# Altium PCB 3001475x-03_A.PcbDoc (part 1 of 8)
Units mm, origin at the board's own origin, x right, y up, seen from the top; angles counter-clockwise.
Board outline 100 x 72 mm, 12 copper layers (Top Layer, L2 GND, Layer 3, L4 GND, Layer 5, L6 PWR, L7 3V3, Layer 8, L9 GND, Layer 10, L11 GND, Bottom Layer), stack 1.735 mm thick; 428 components, 499 nets, 1973 pads, 1473 vias.
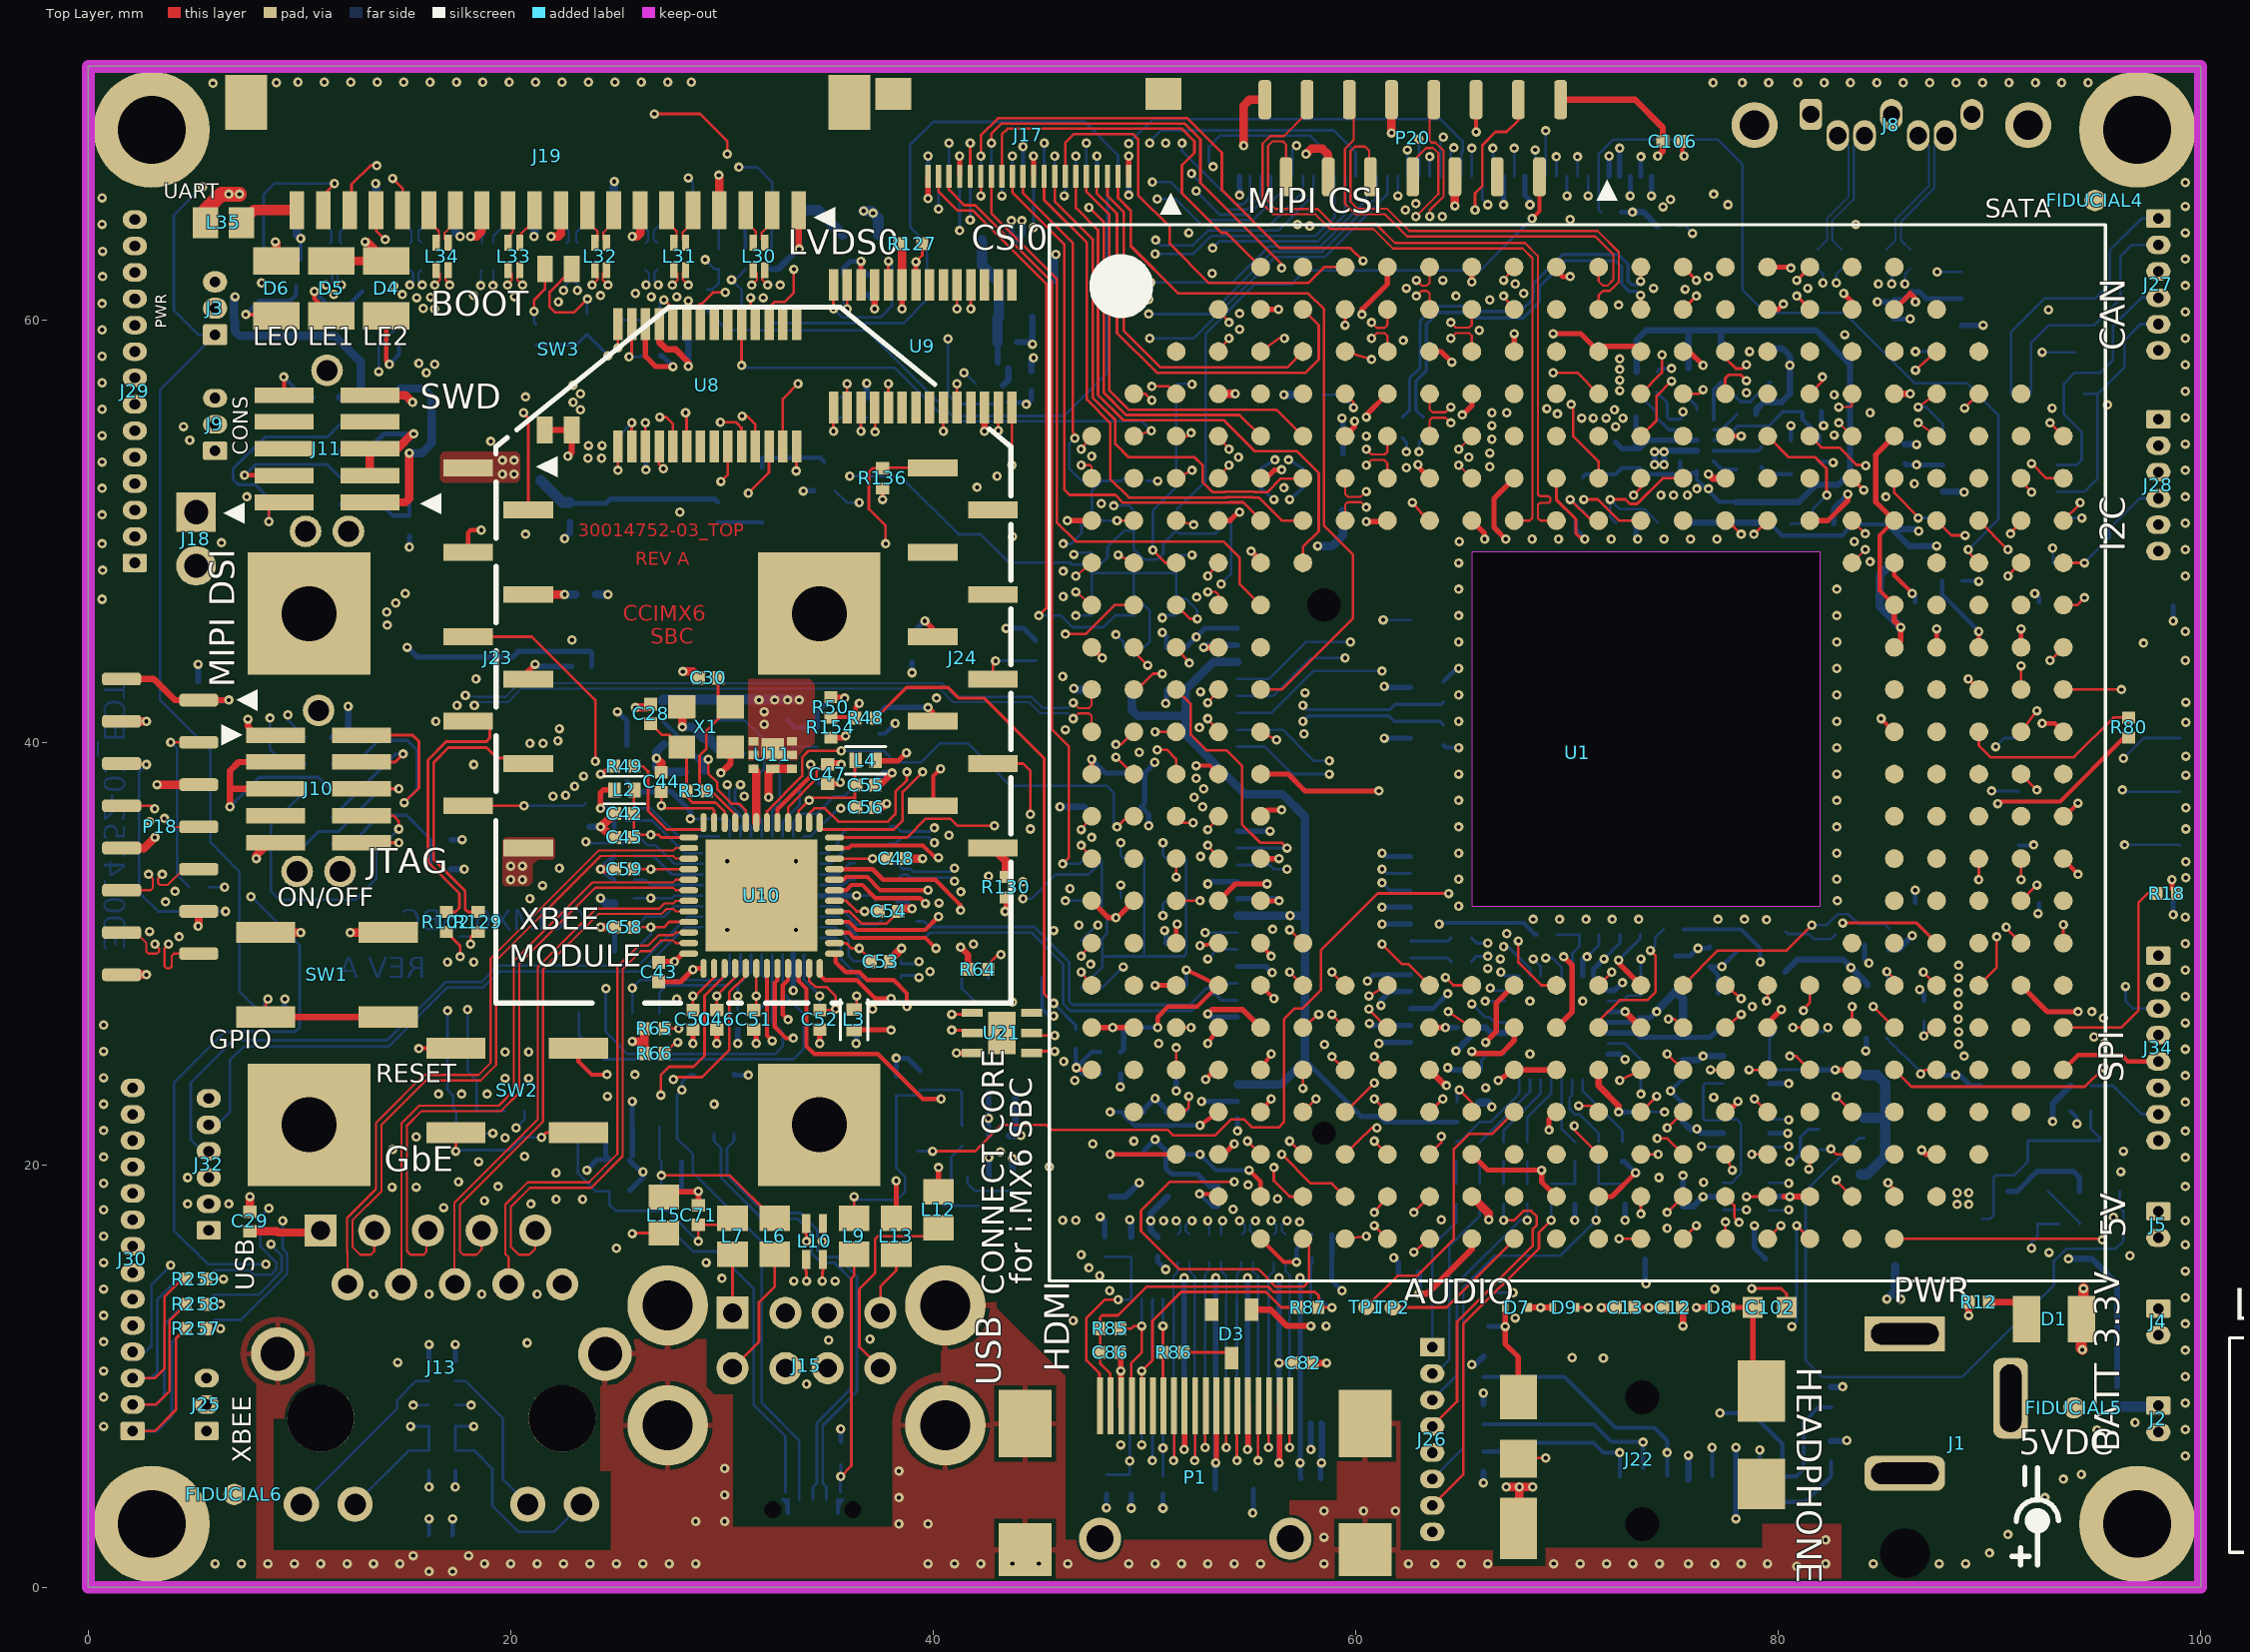
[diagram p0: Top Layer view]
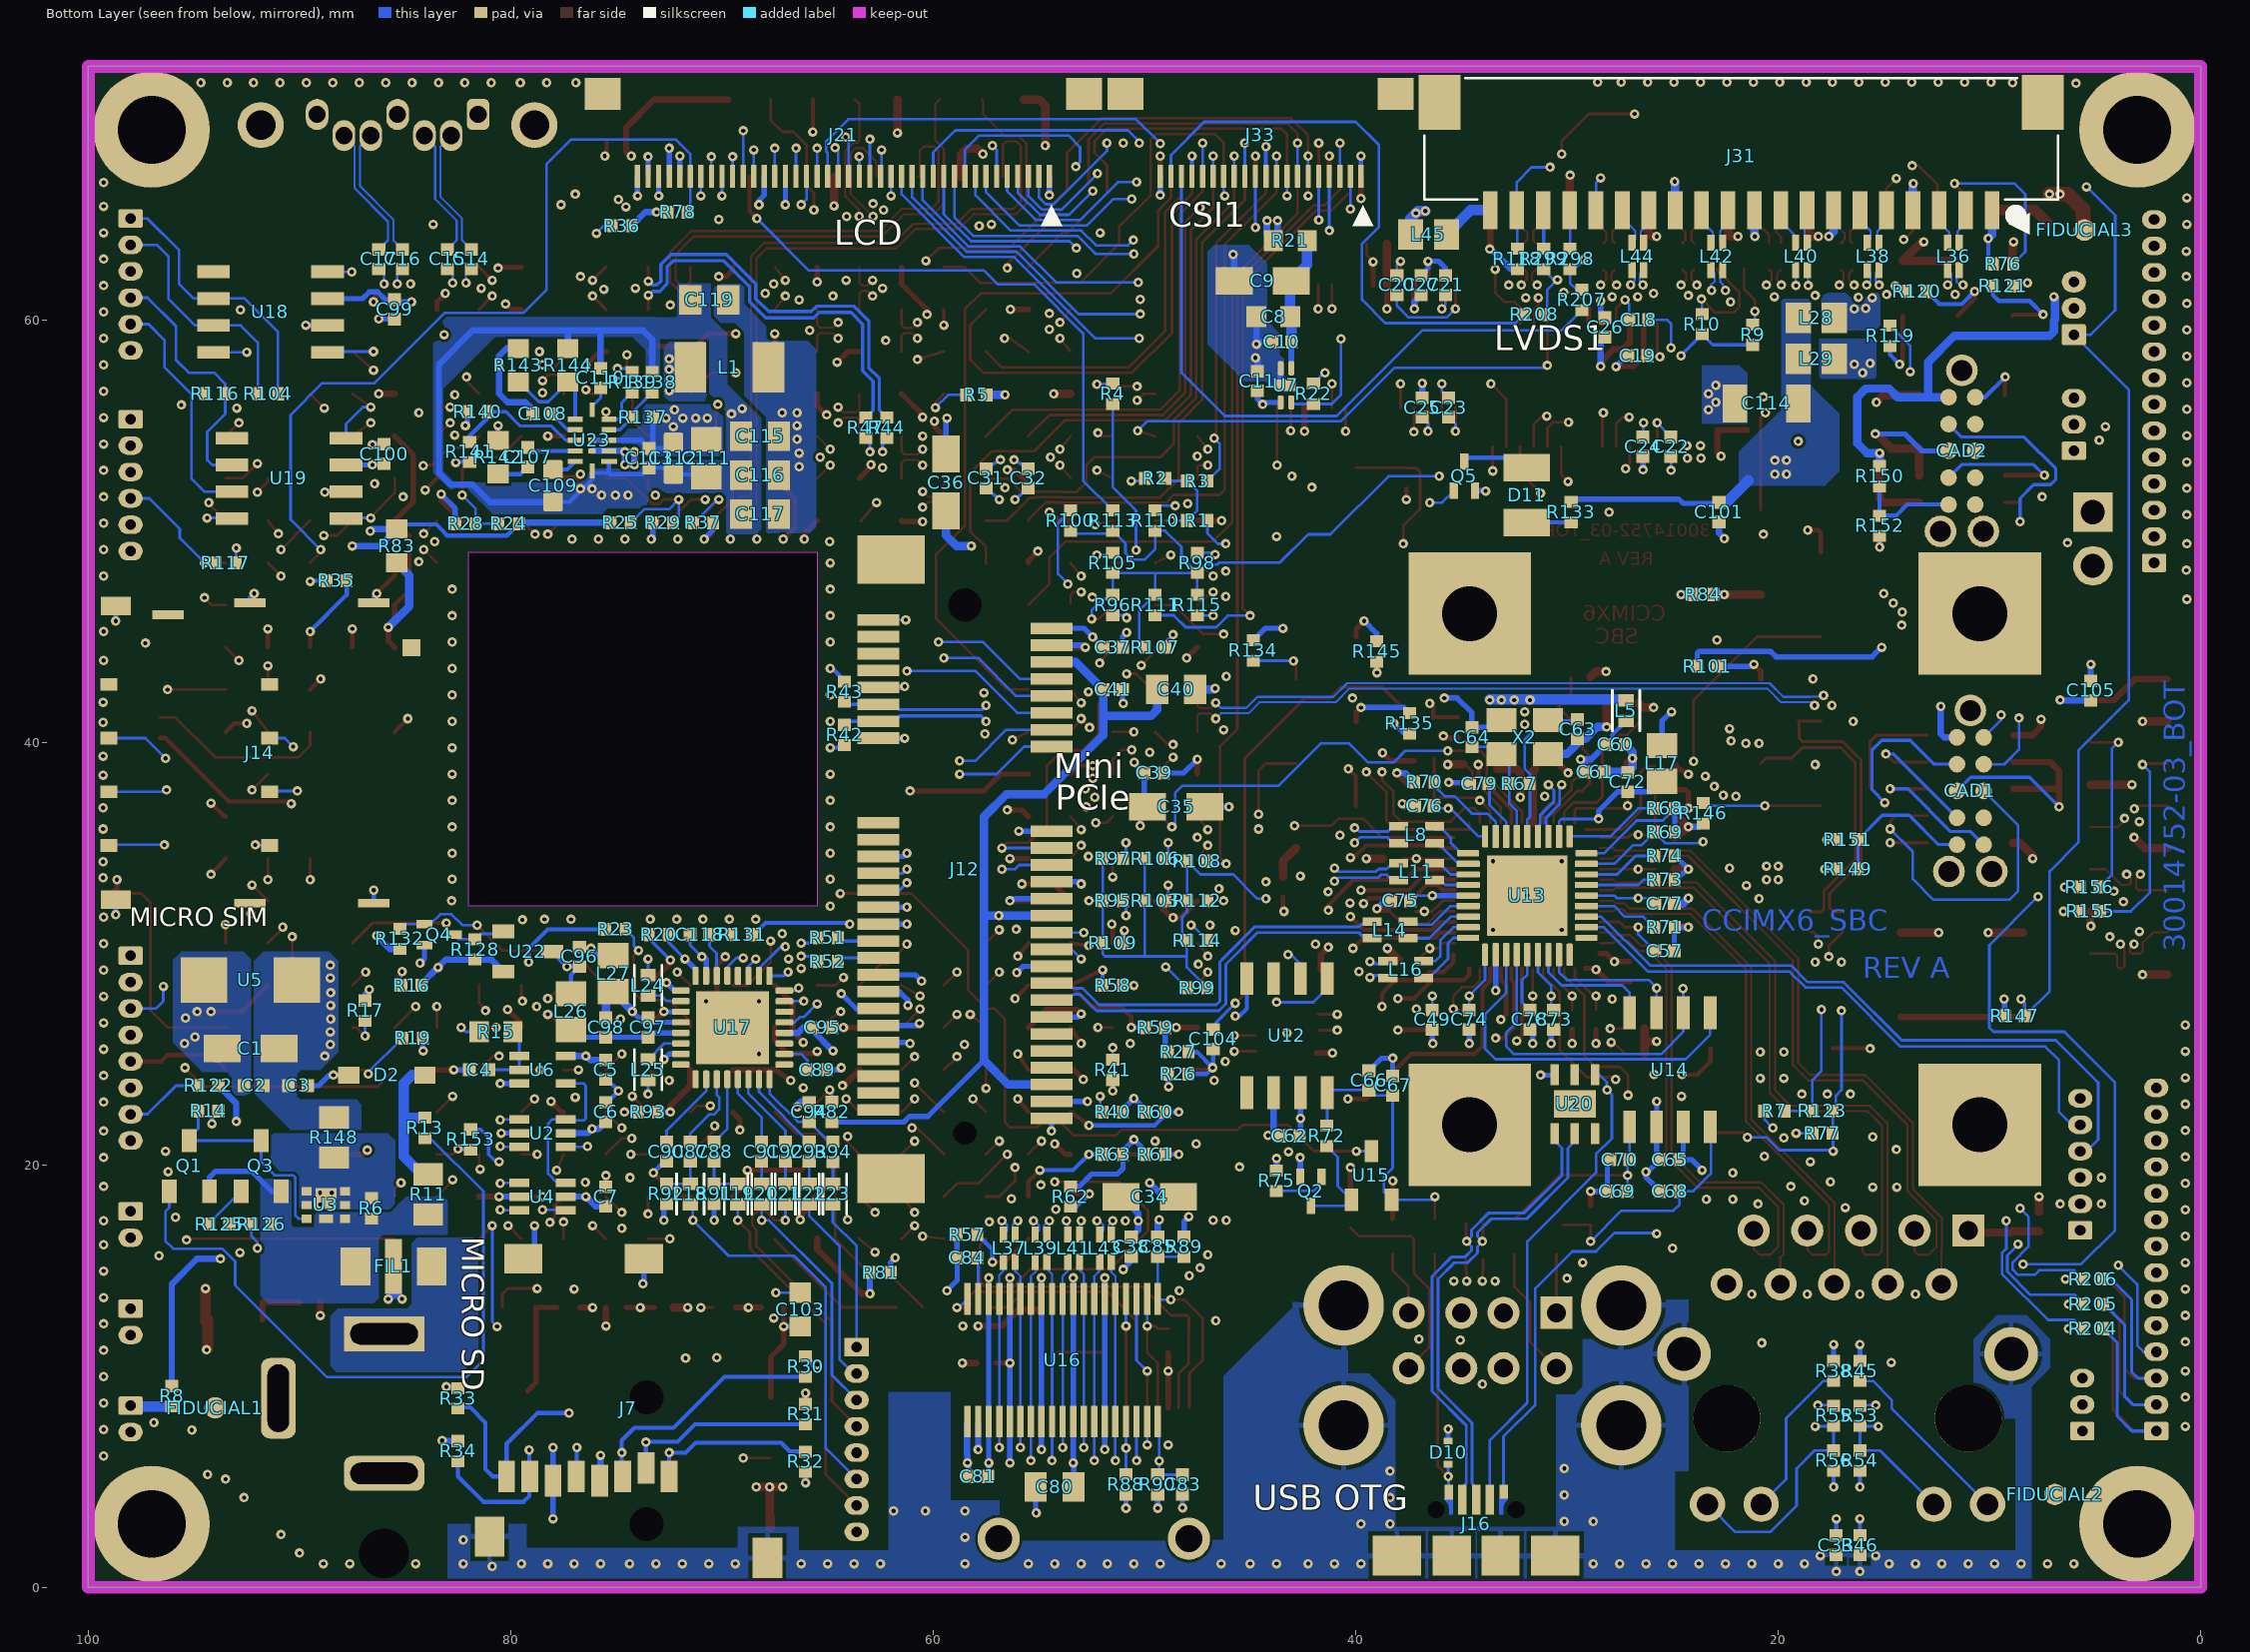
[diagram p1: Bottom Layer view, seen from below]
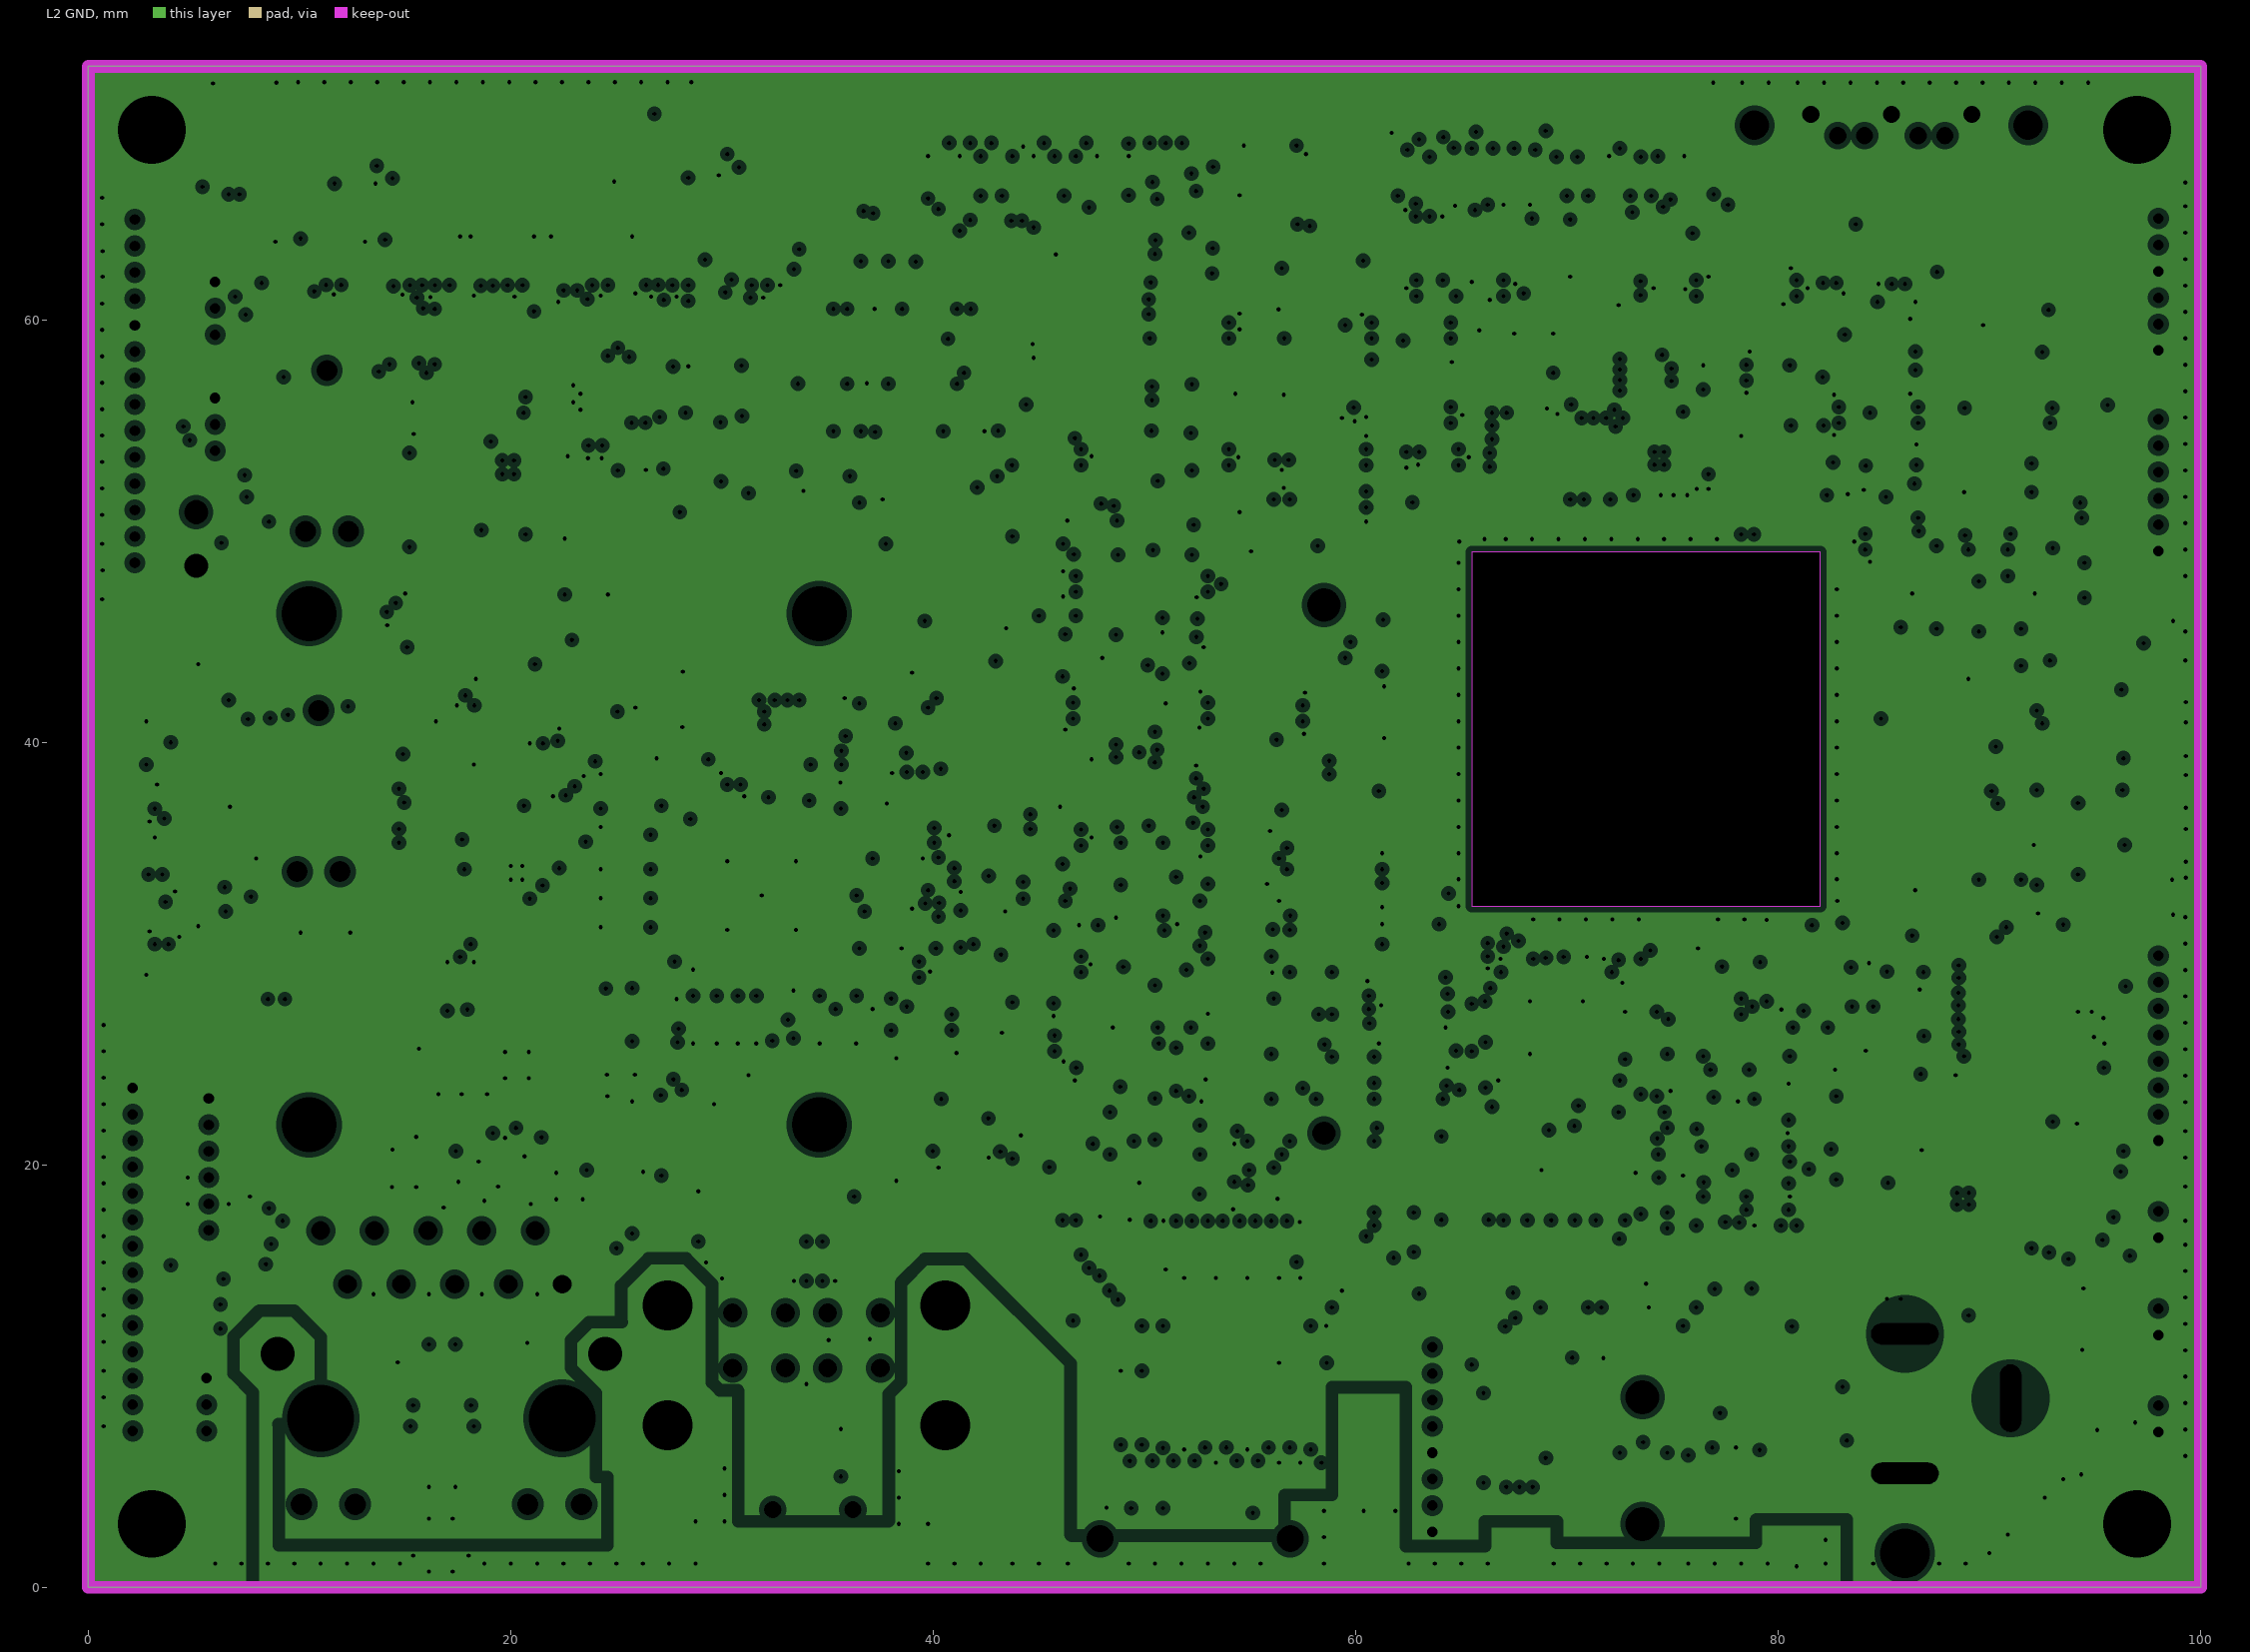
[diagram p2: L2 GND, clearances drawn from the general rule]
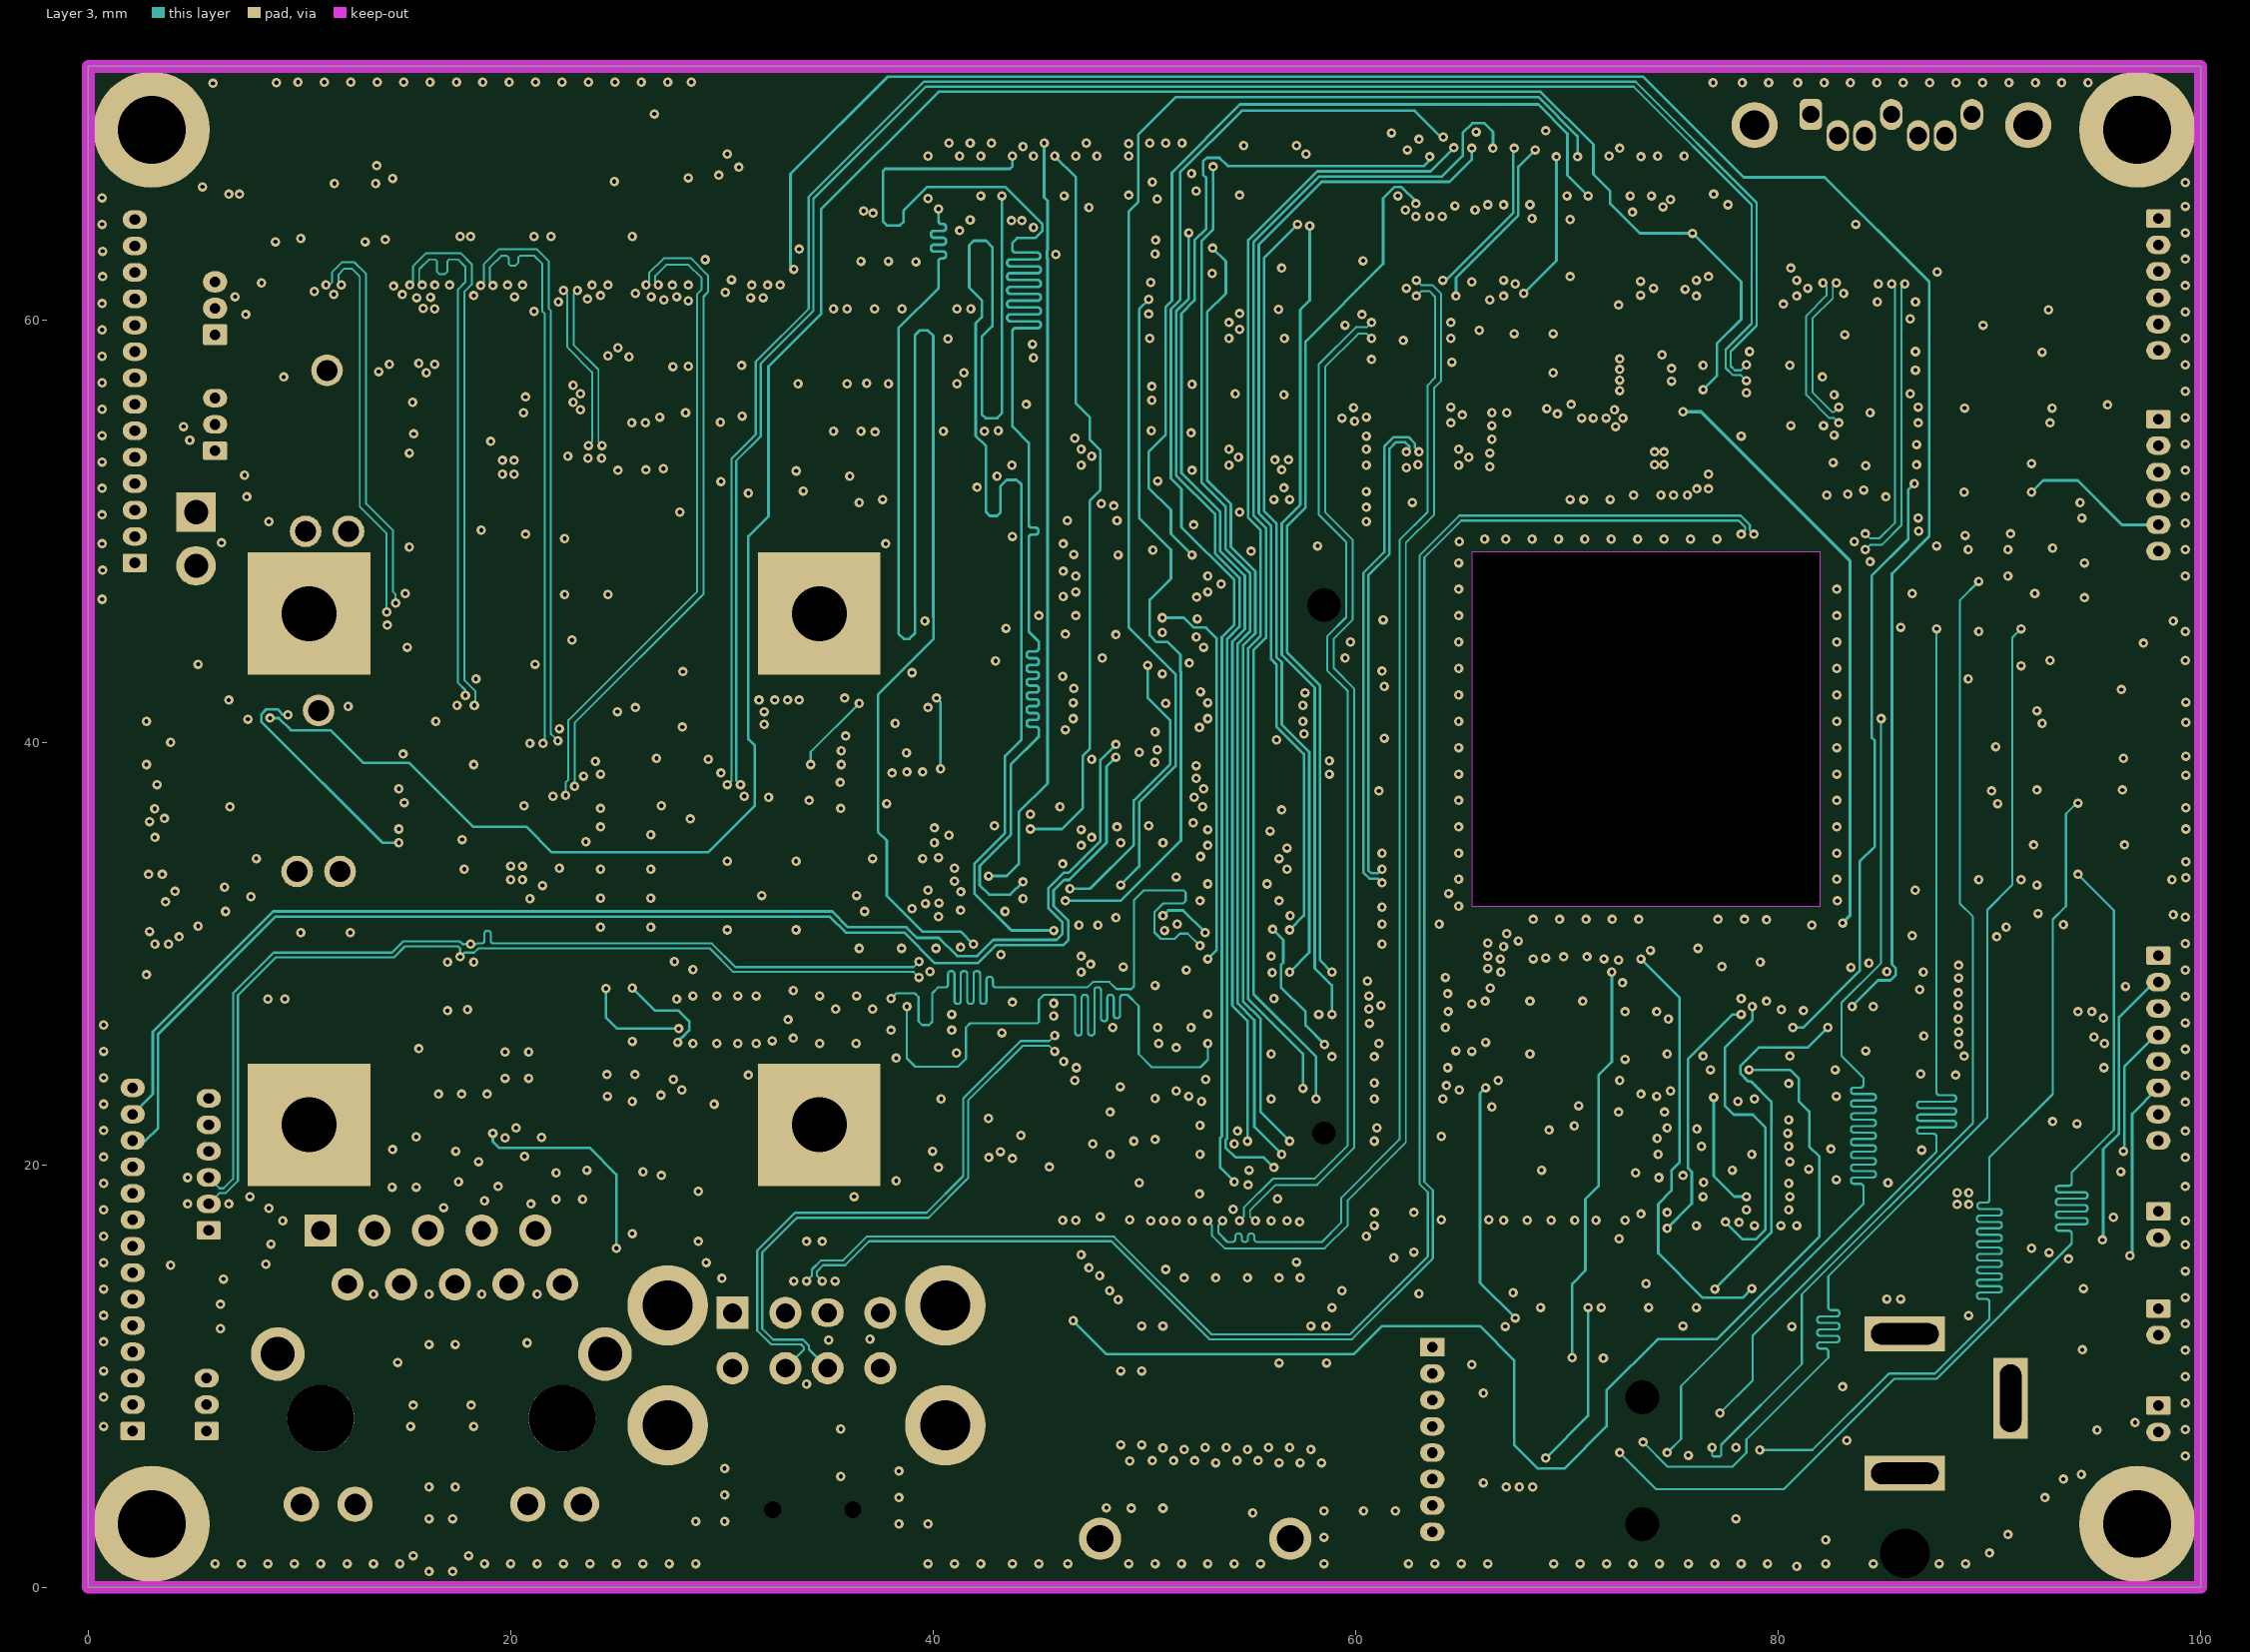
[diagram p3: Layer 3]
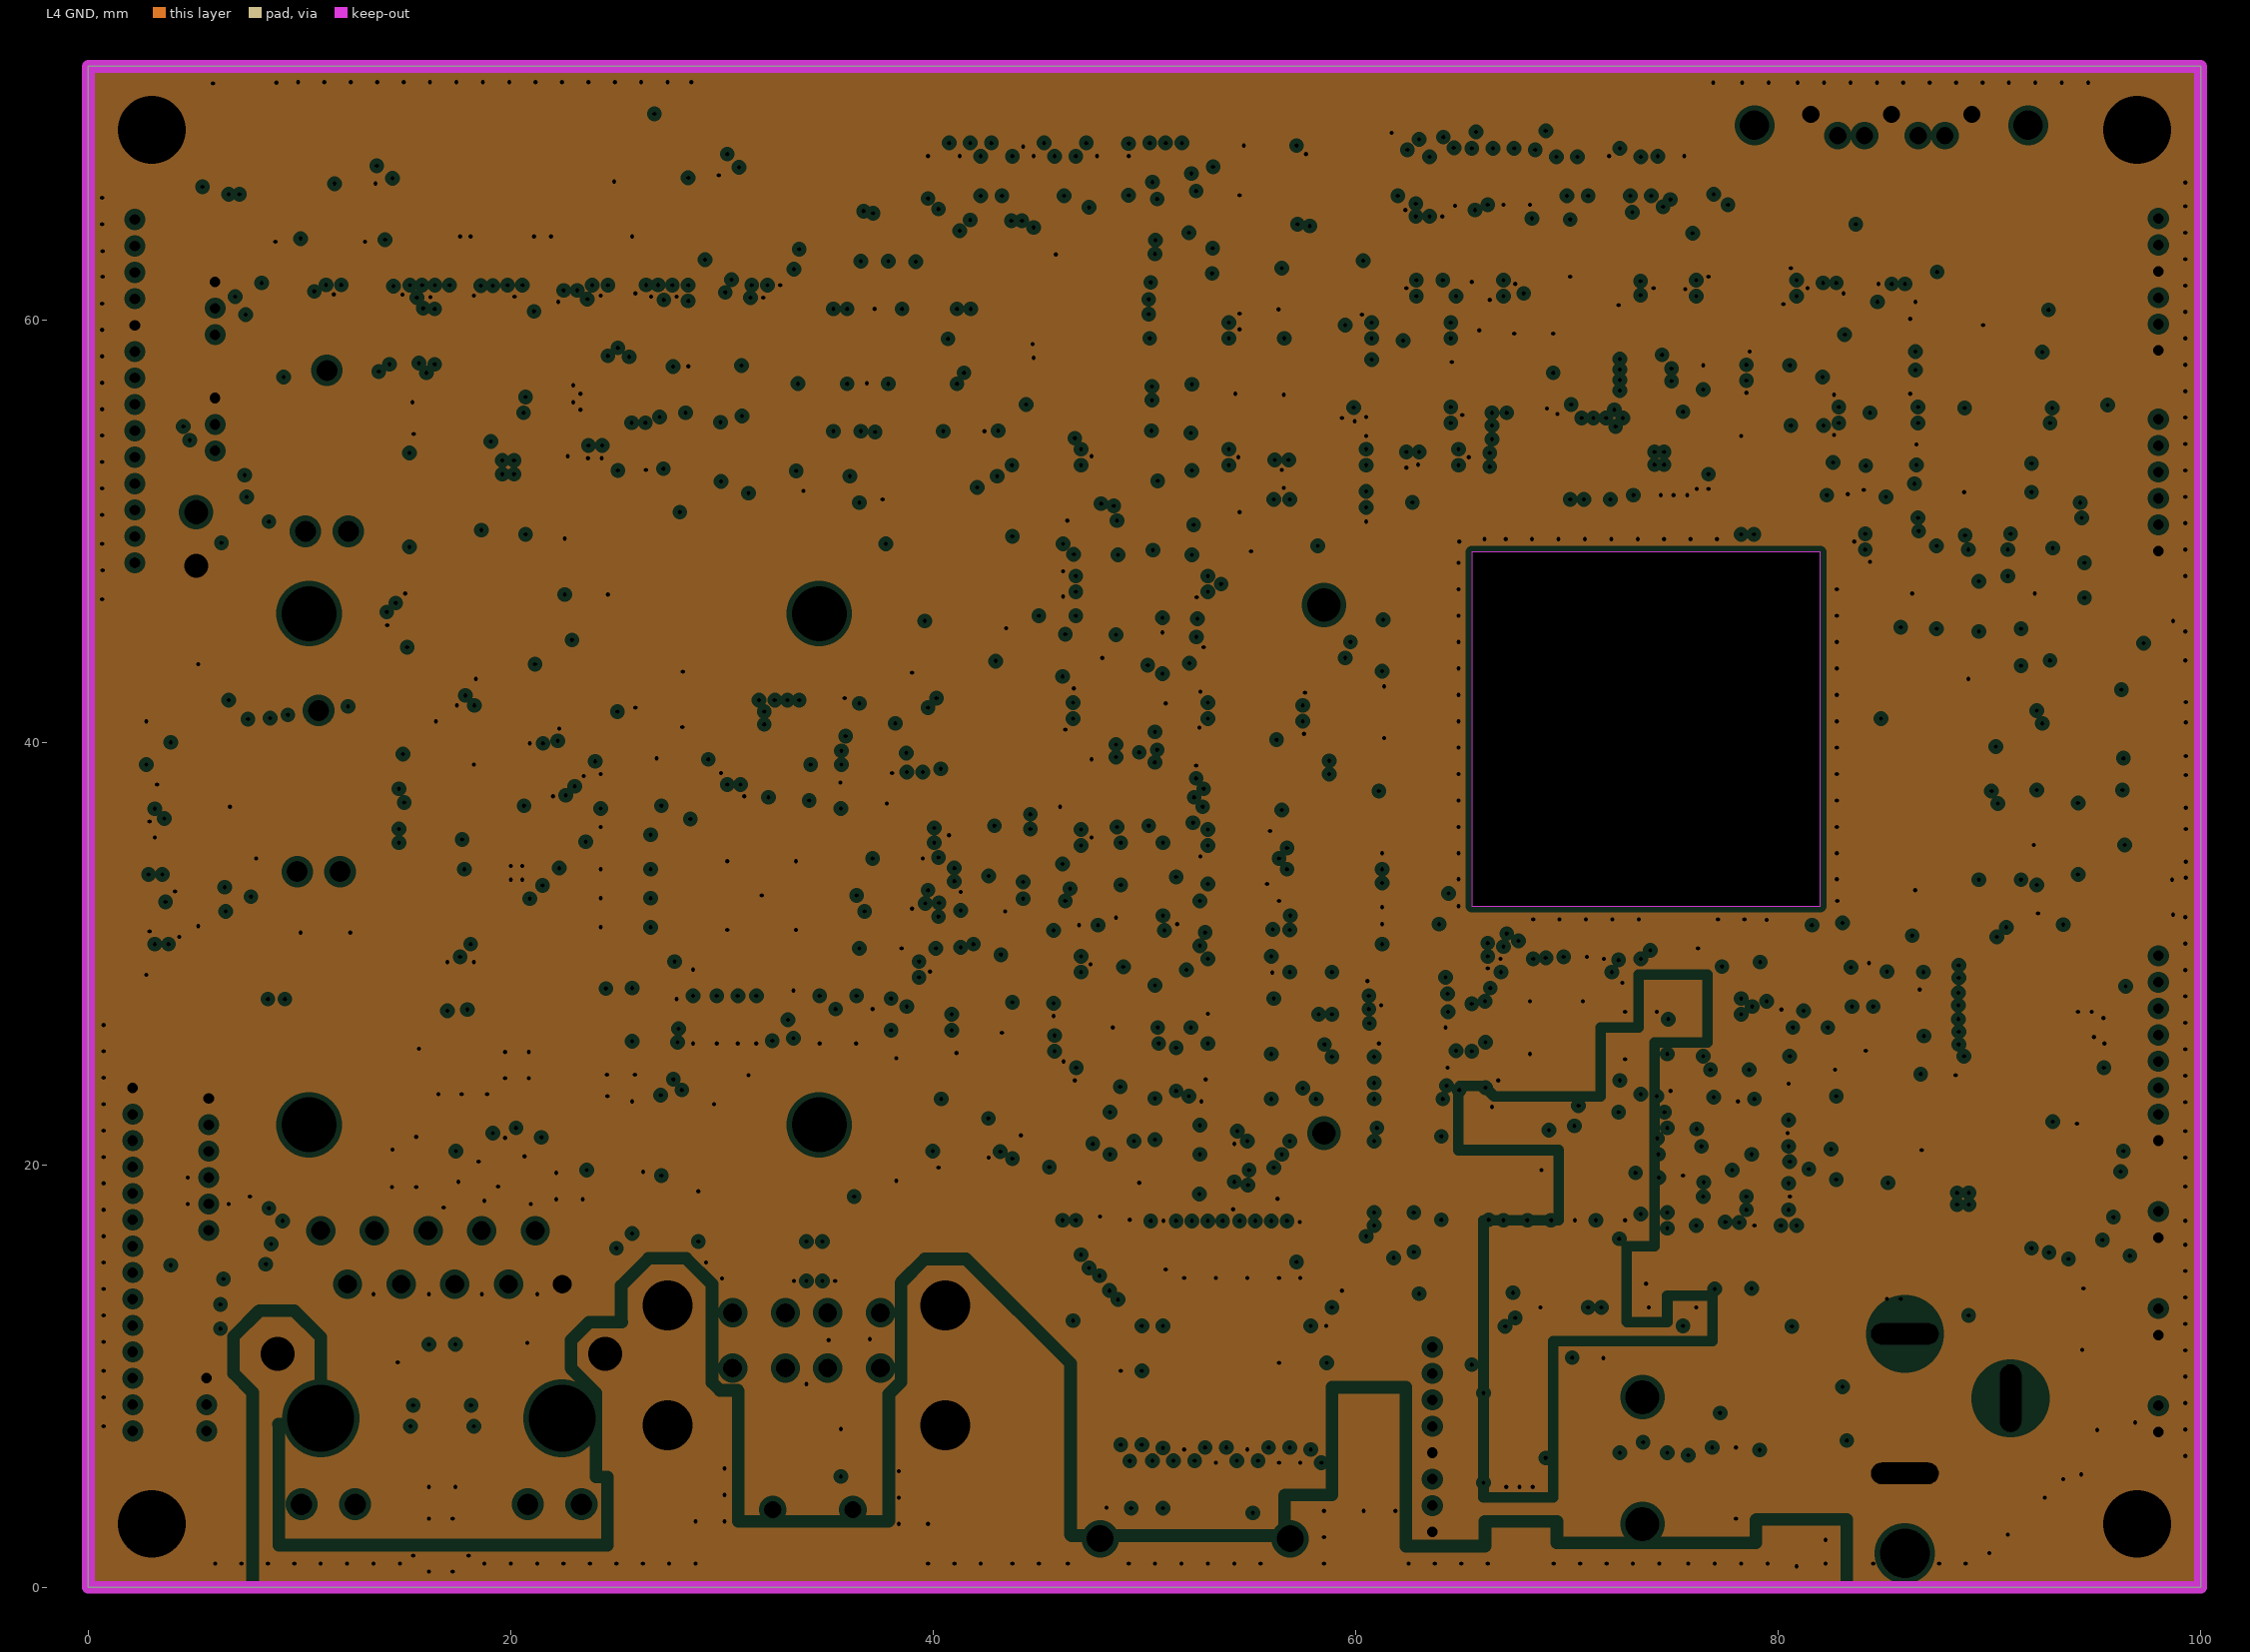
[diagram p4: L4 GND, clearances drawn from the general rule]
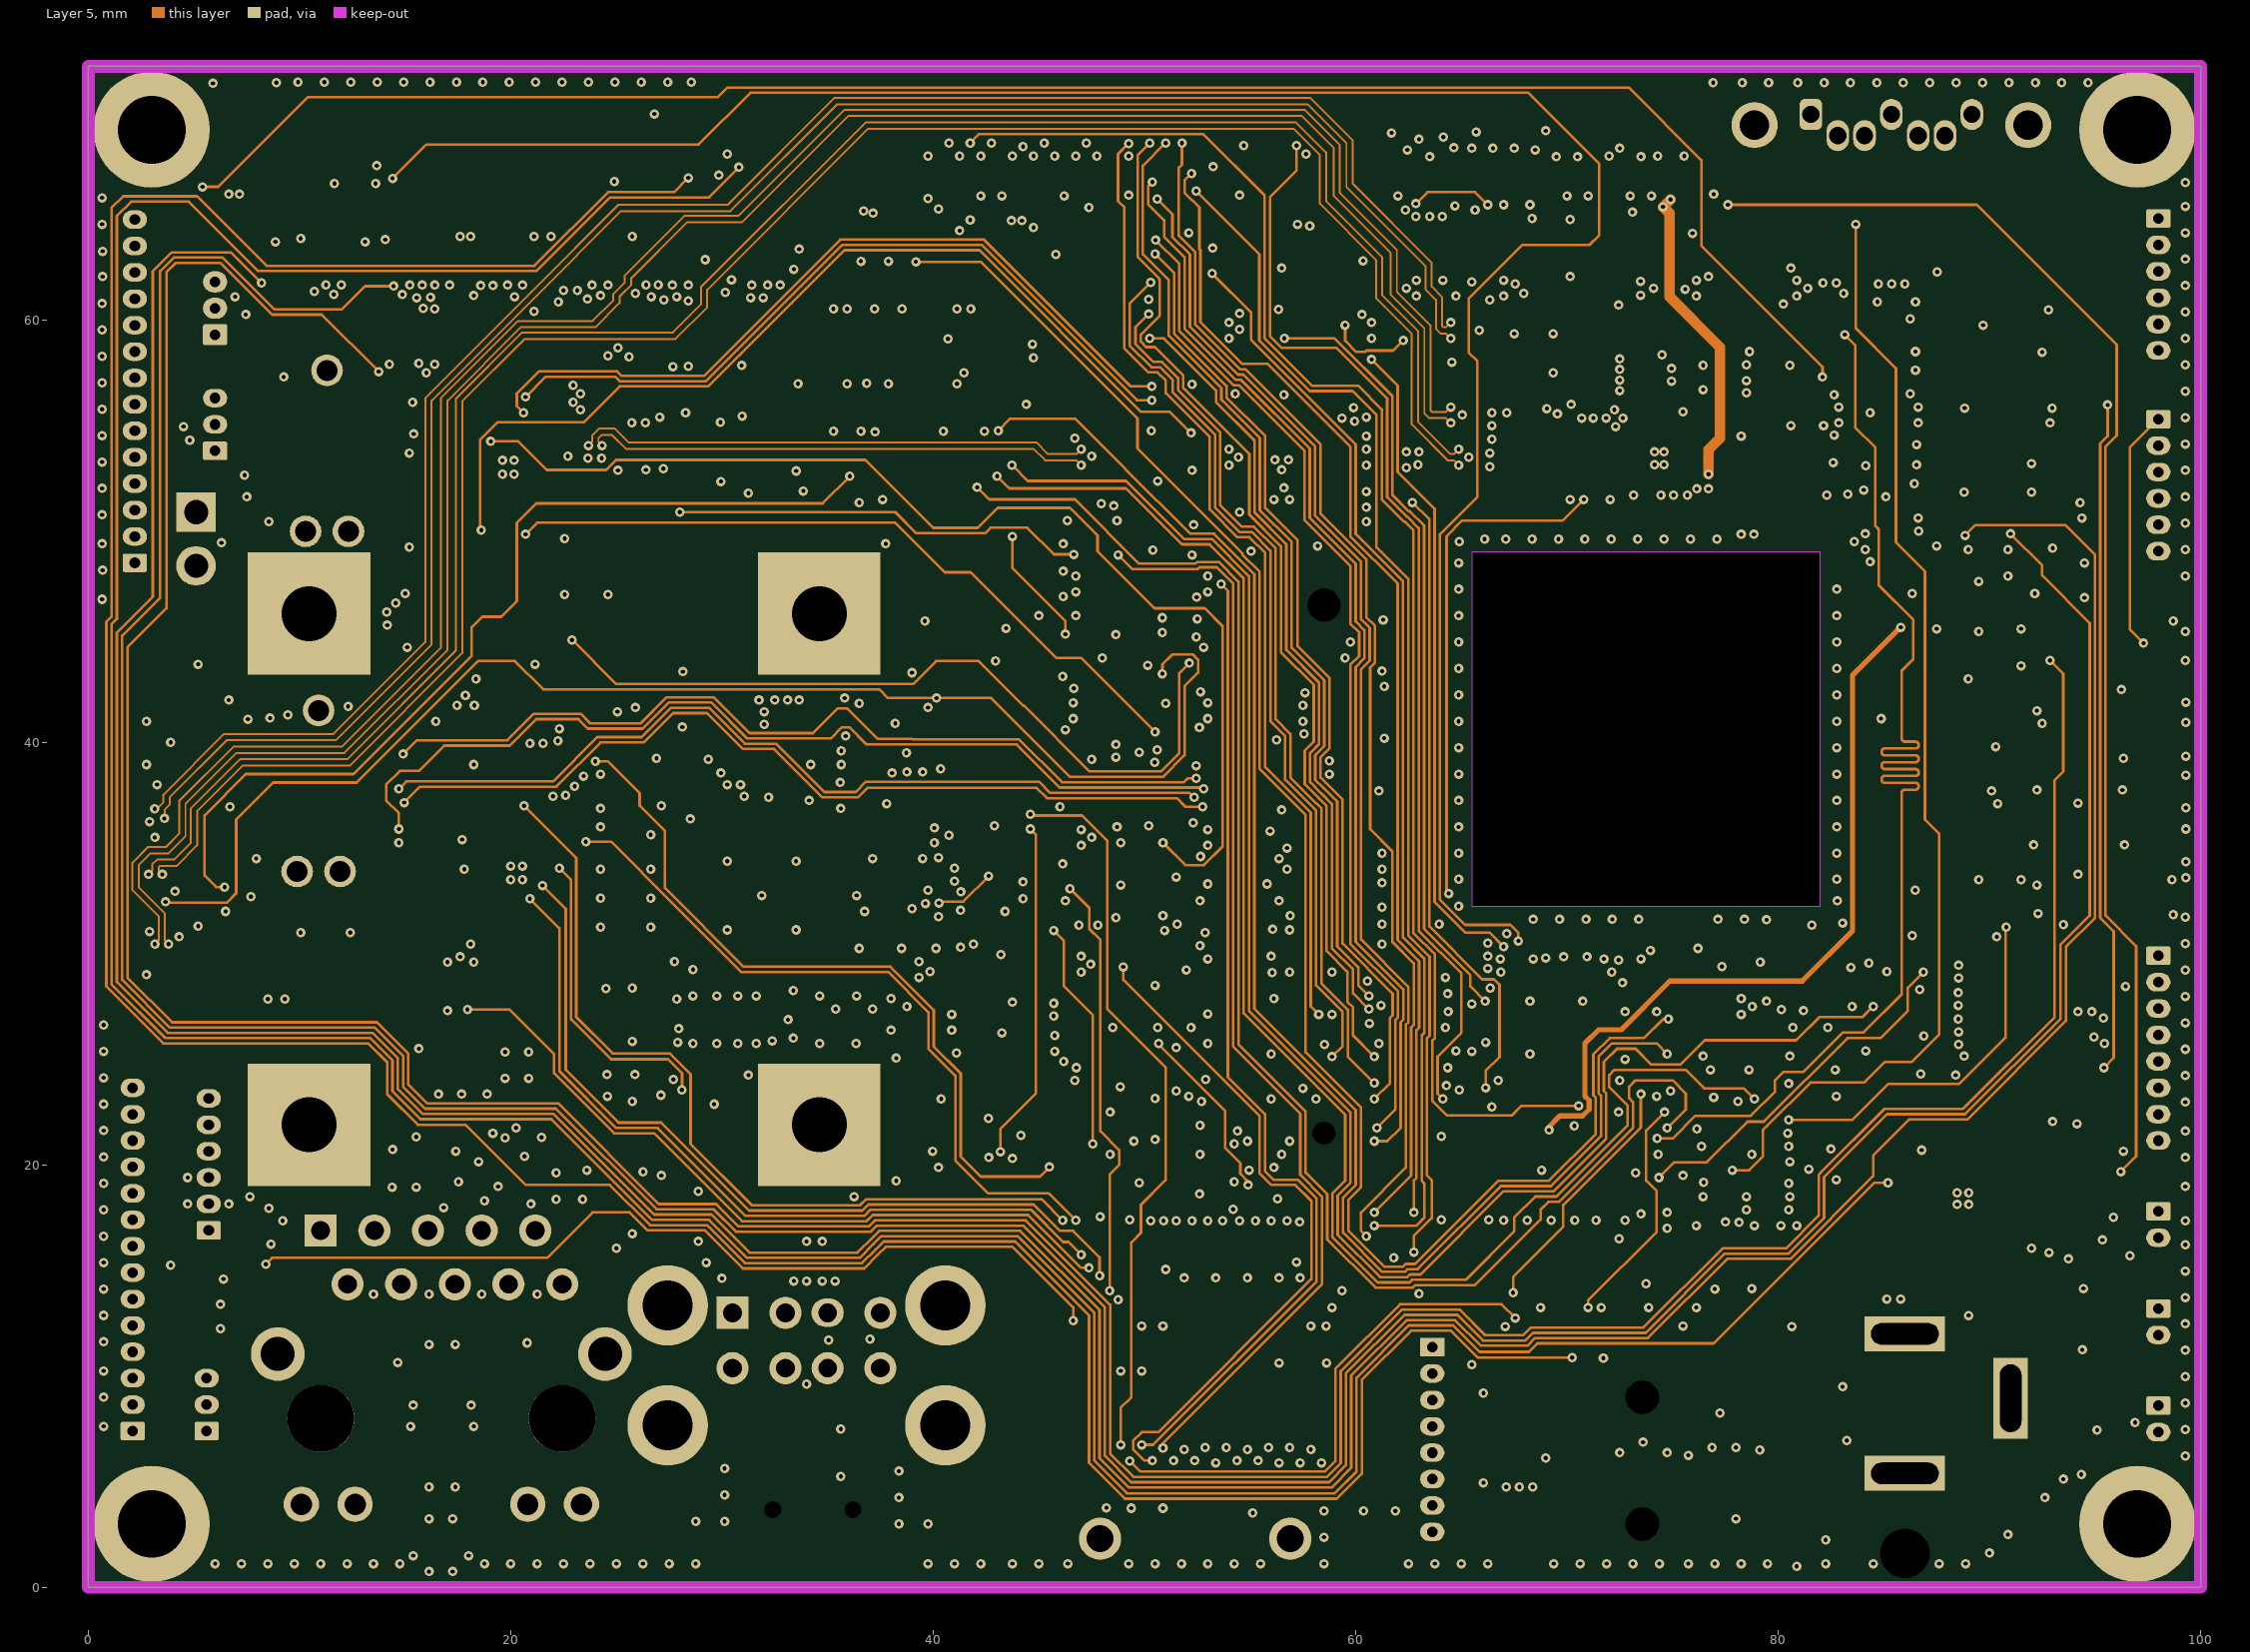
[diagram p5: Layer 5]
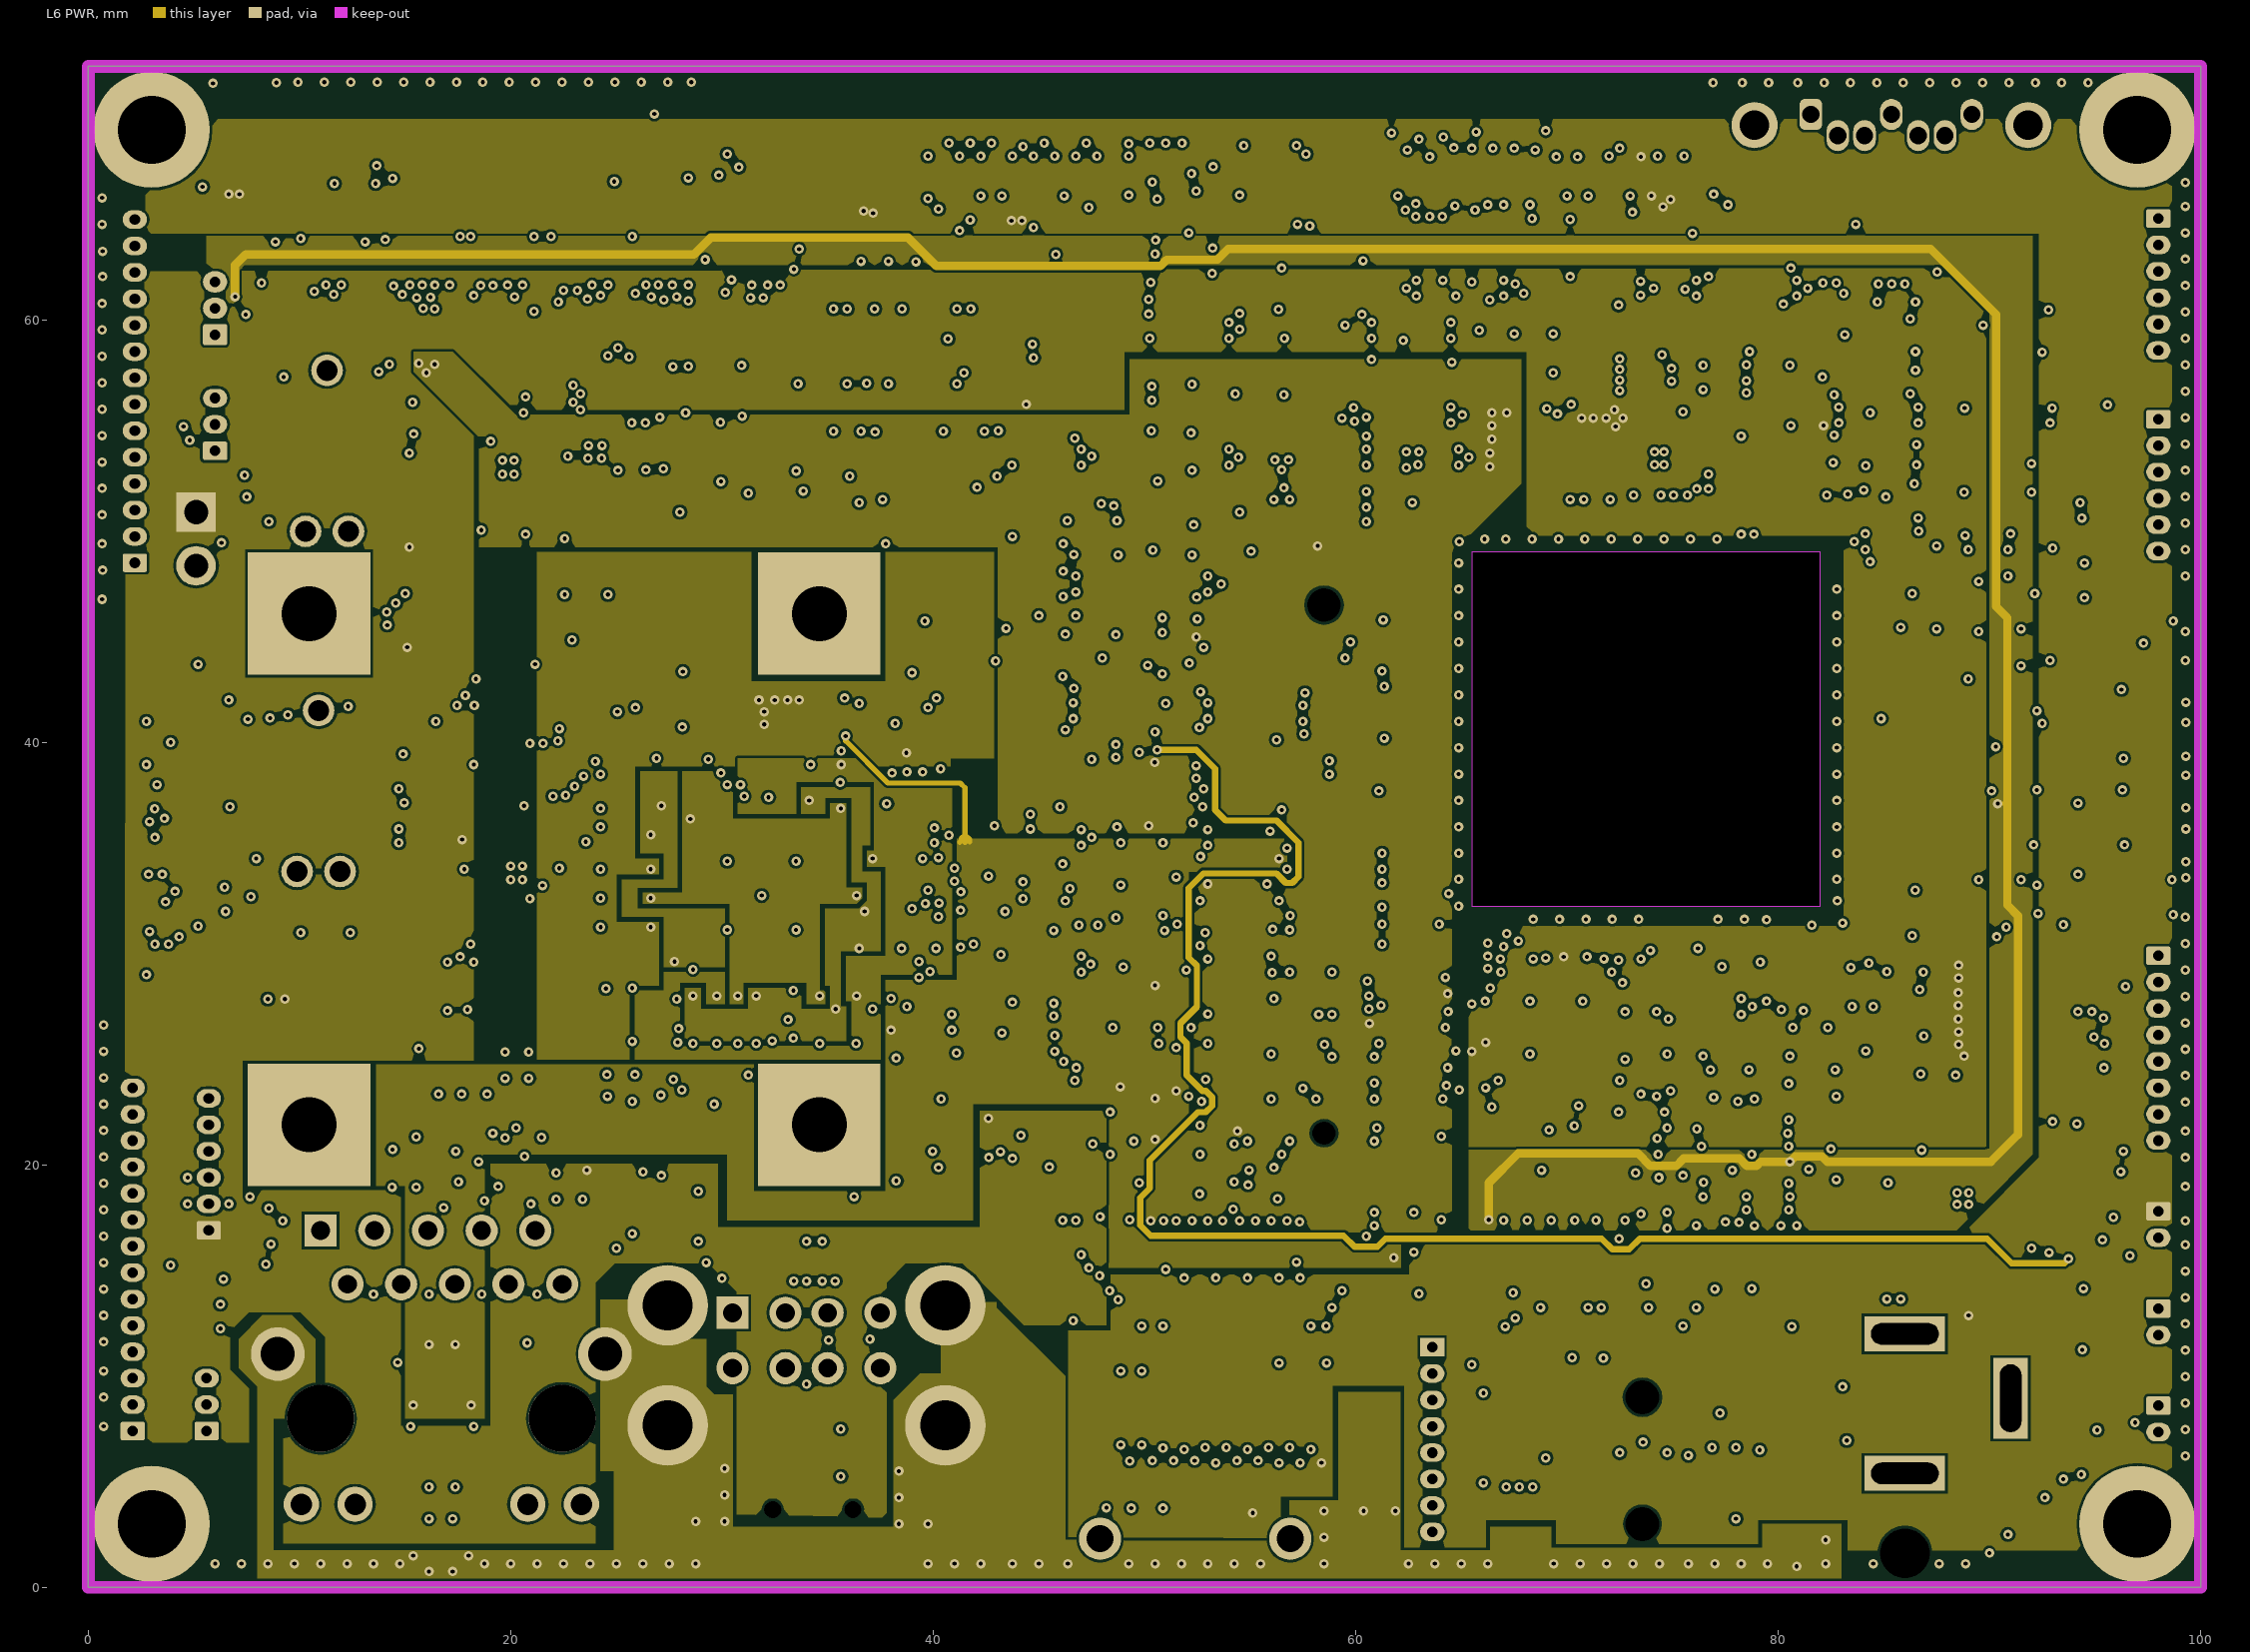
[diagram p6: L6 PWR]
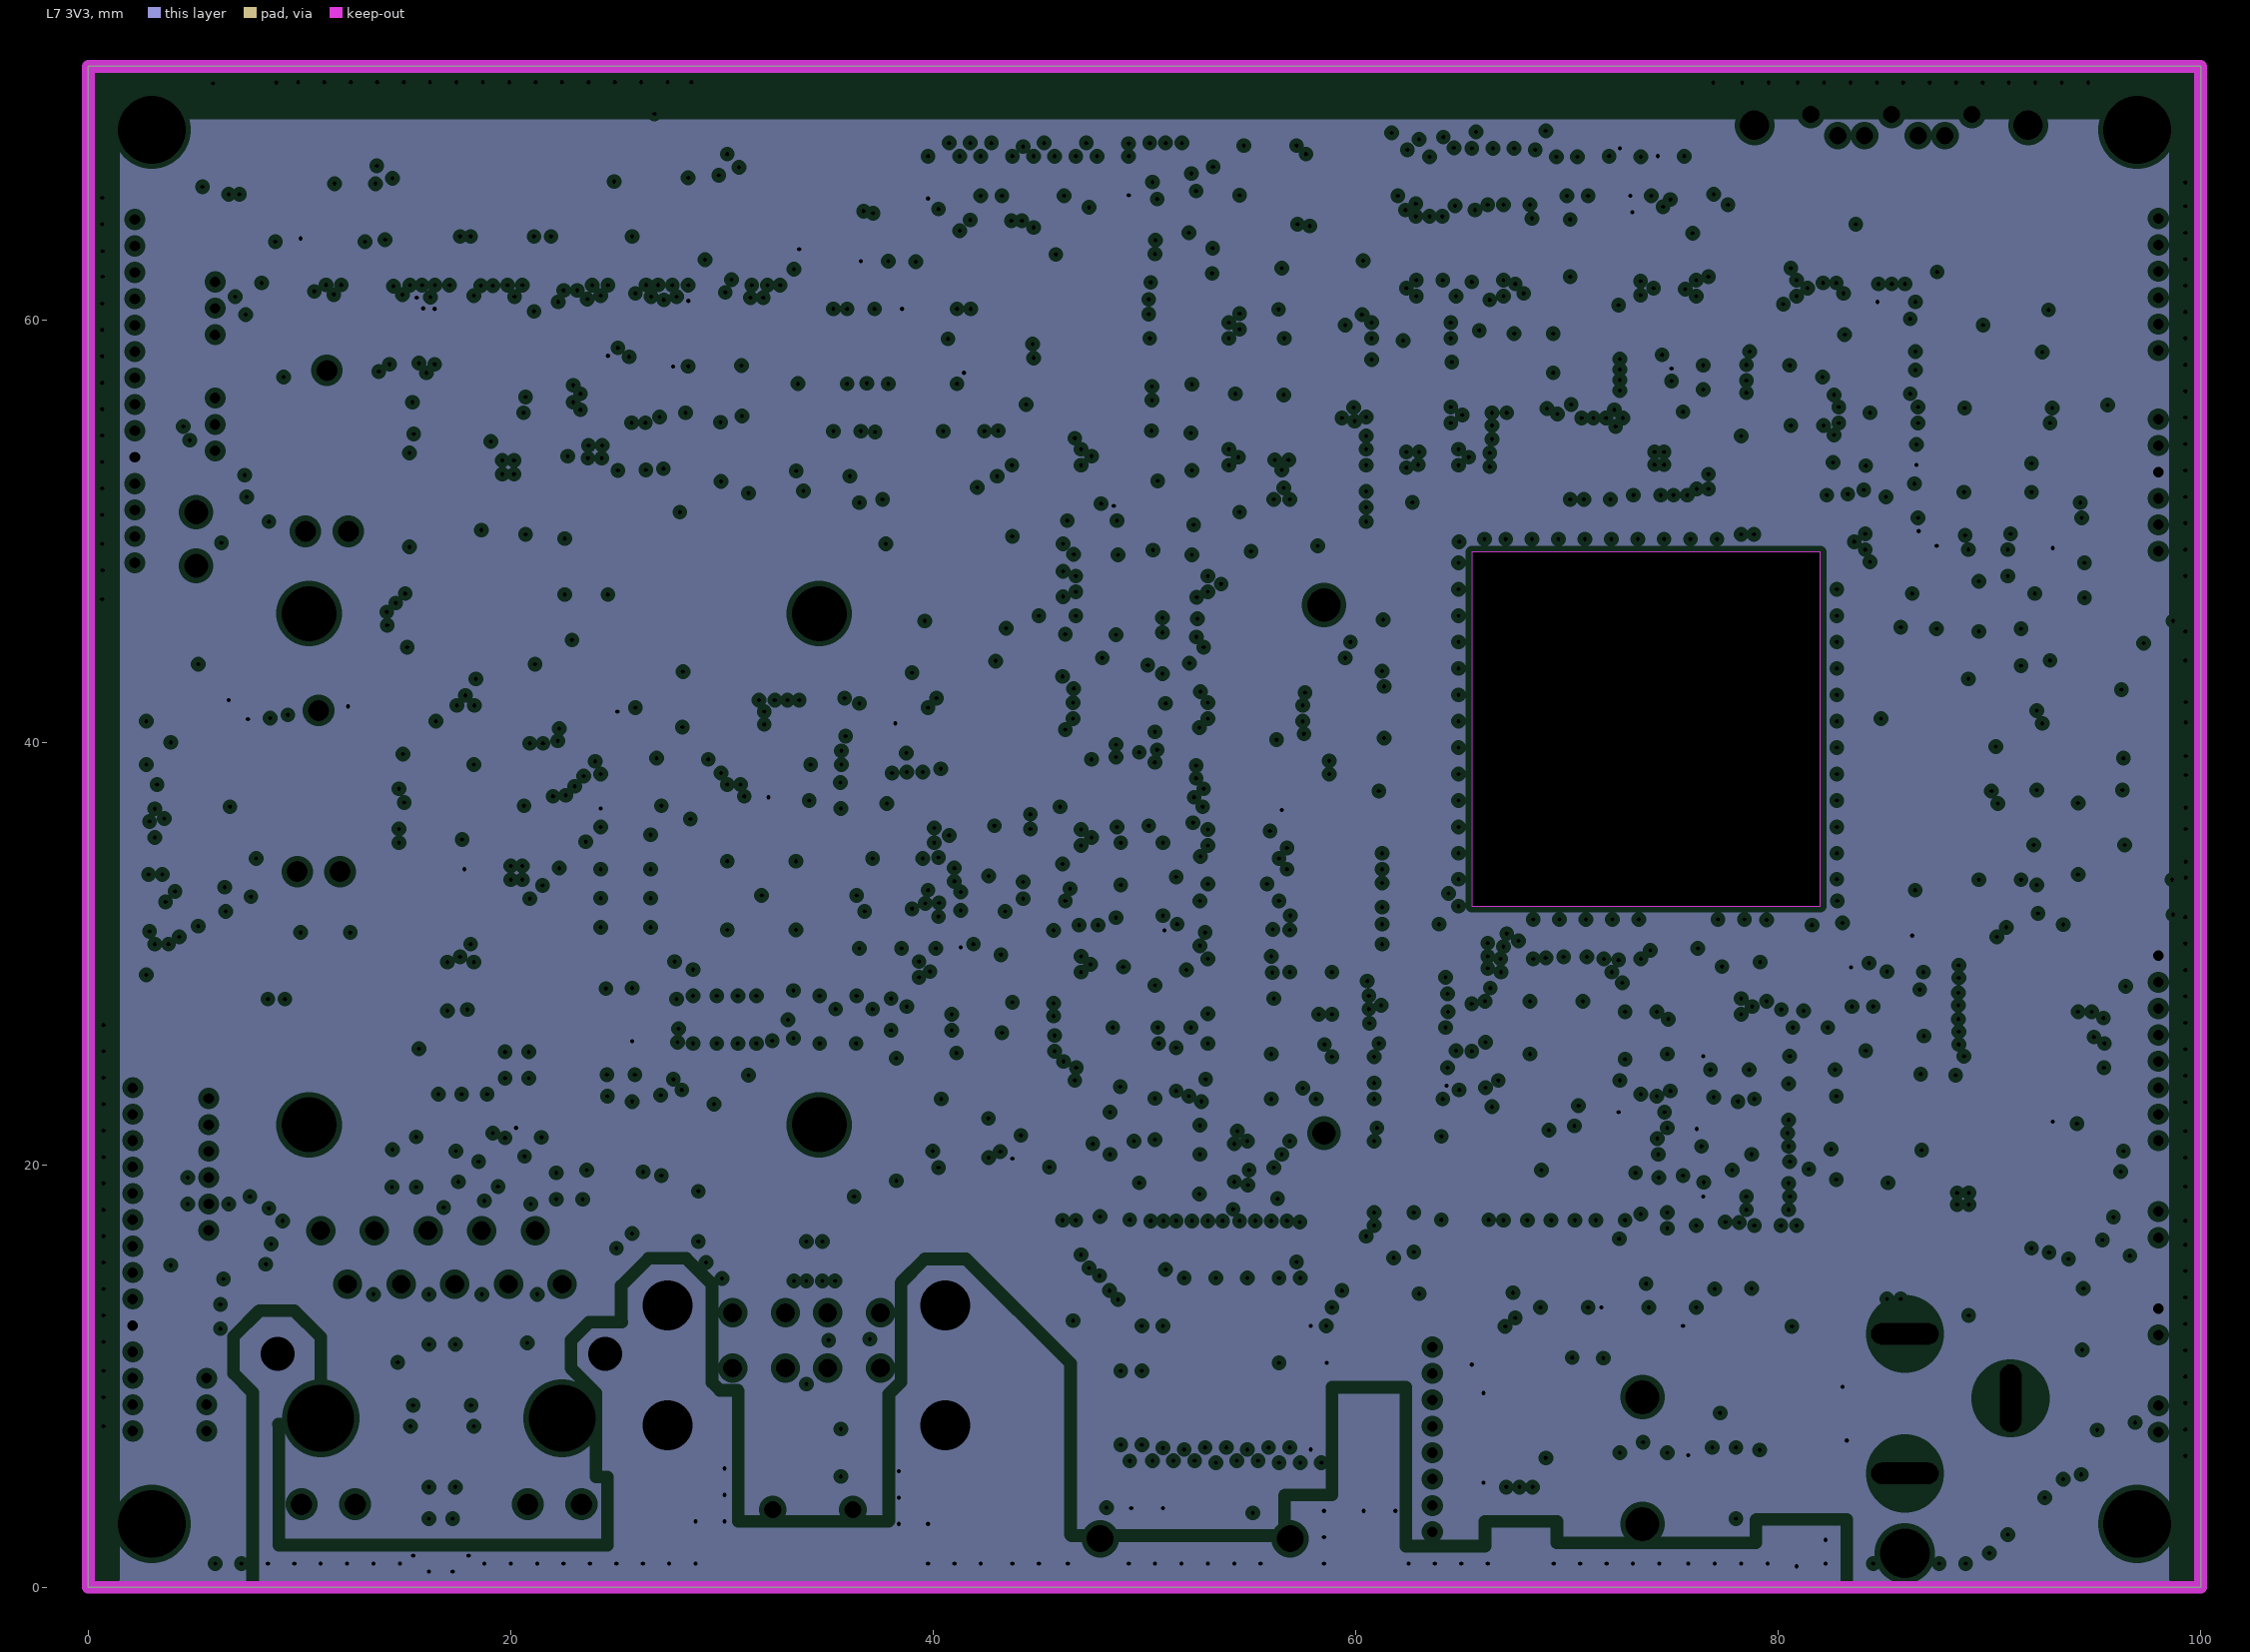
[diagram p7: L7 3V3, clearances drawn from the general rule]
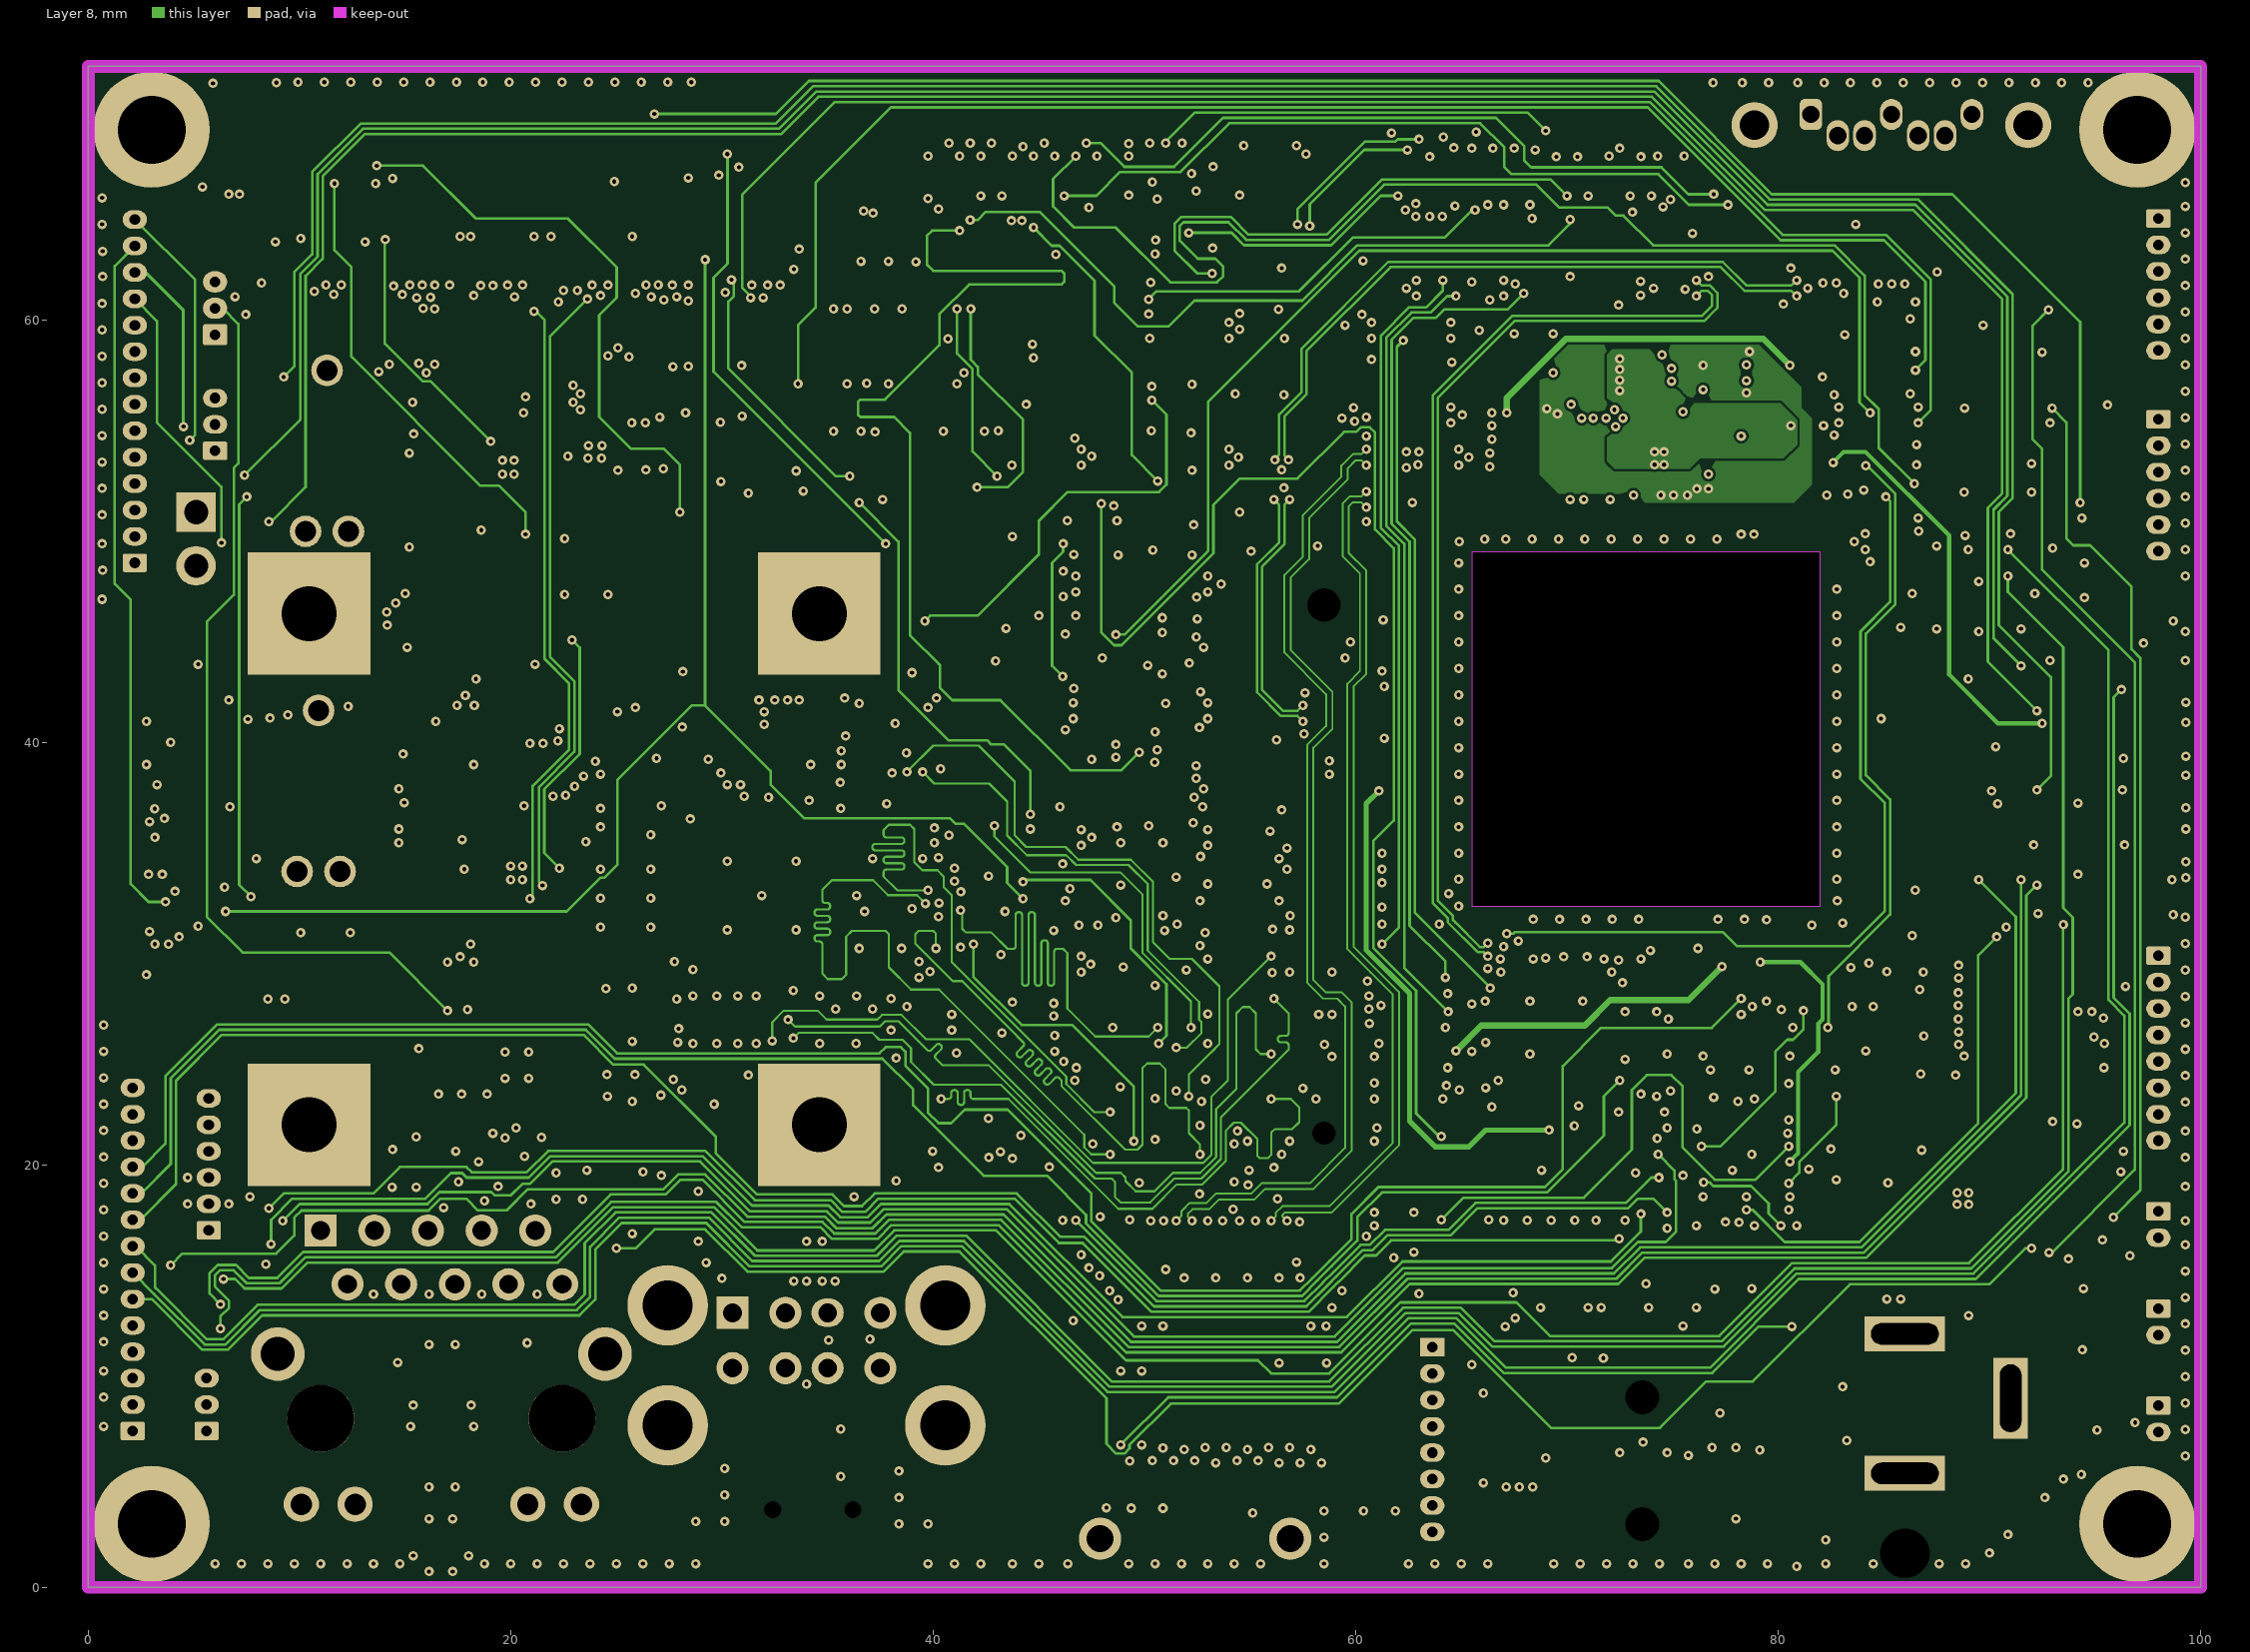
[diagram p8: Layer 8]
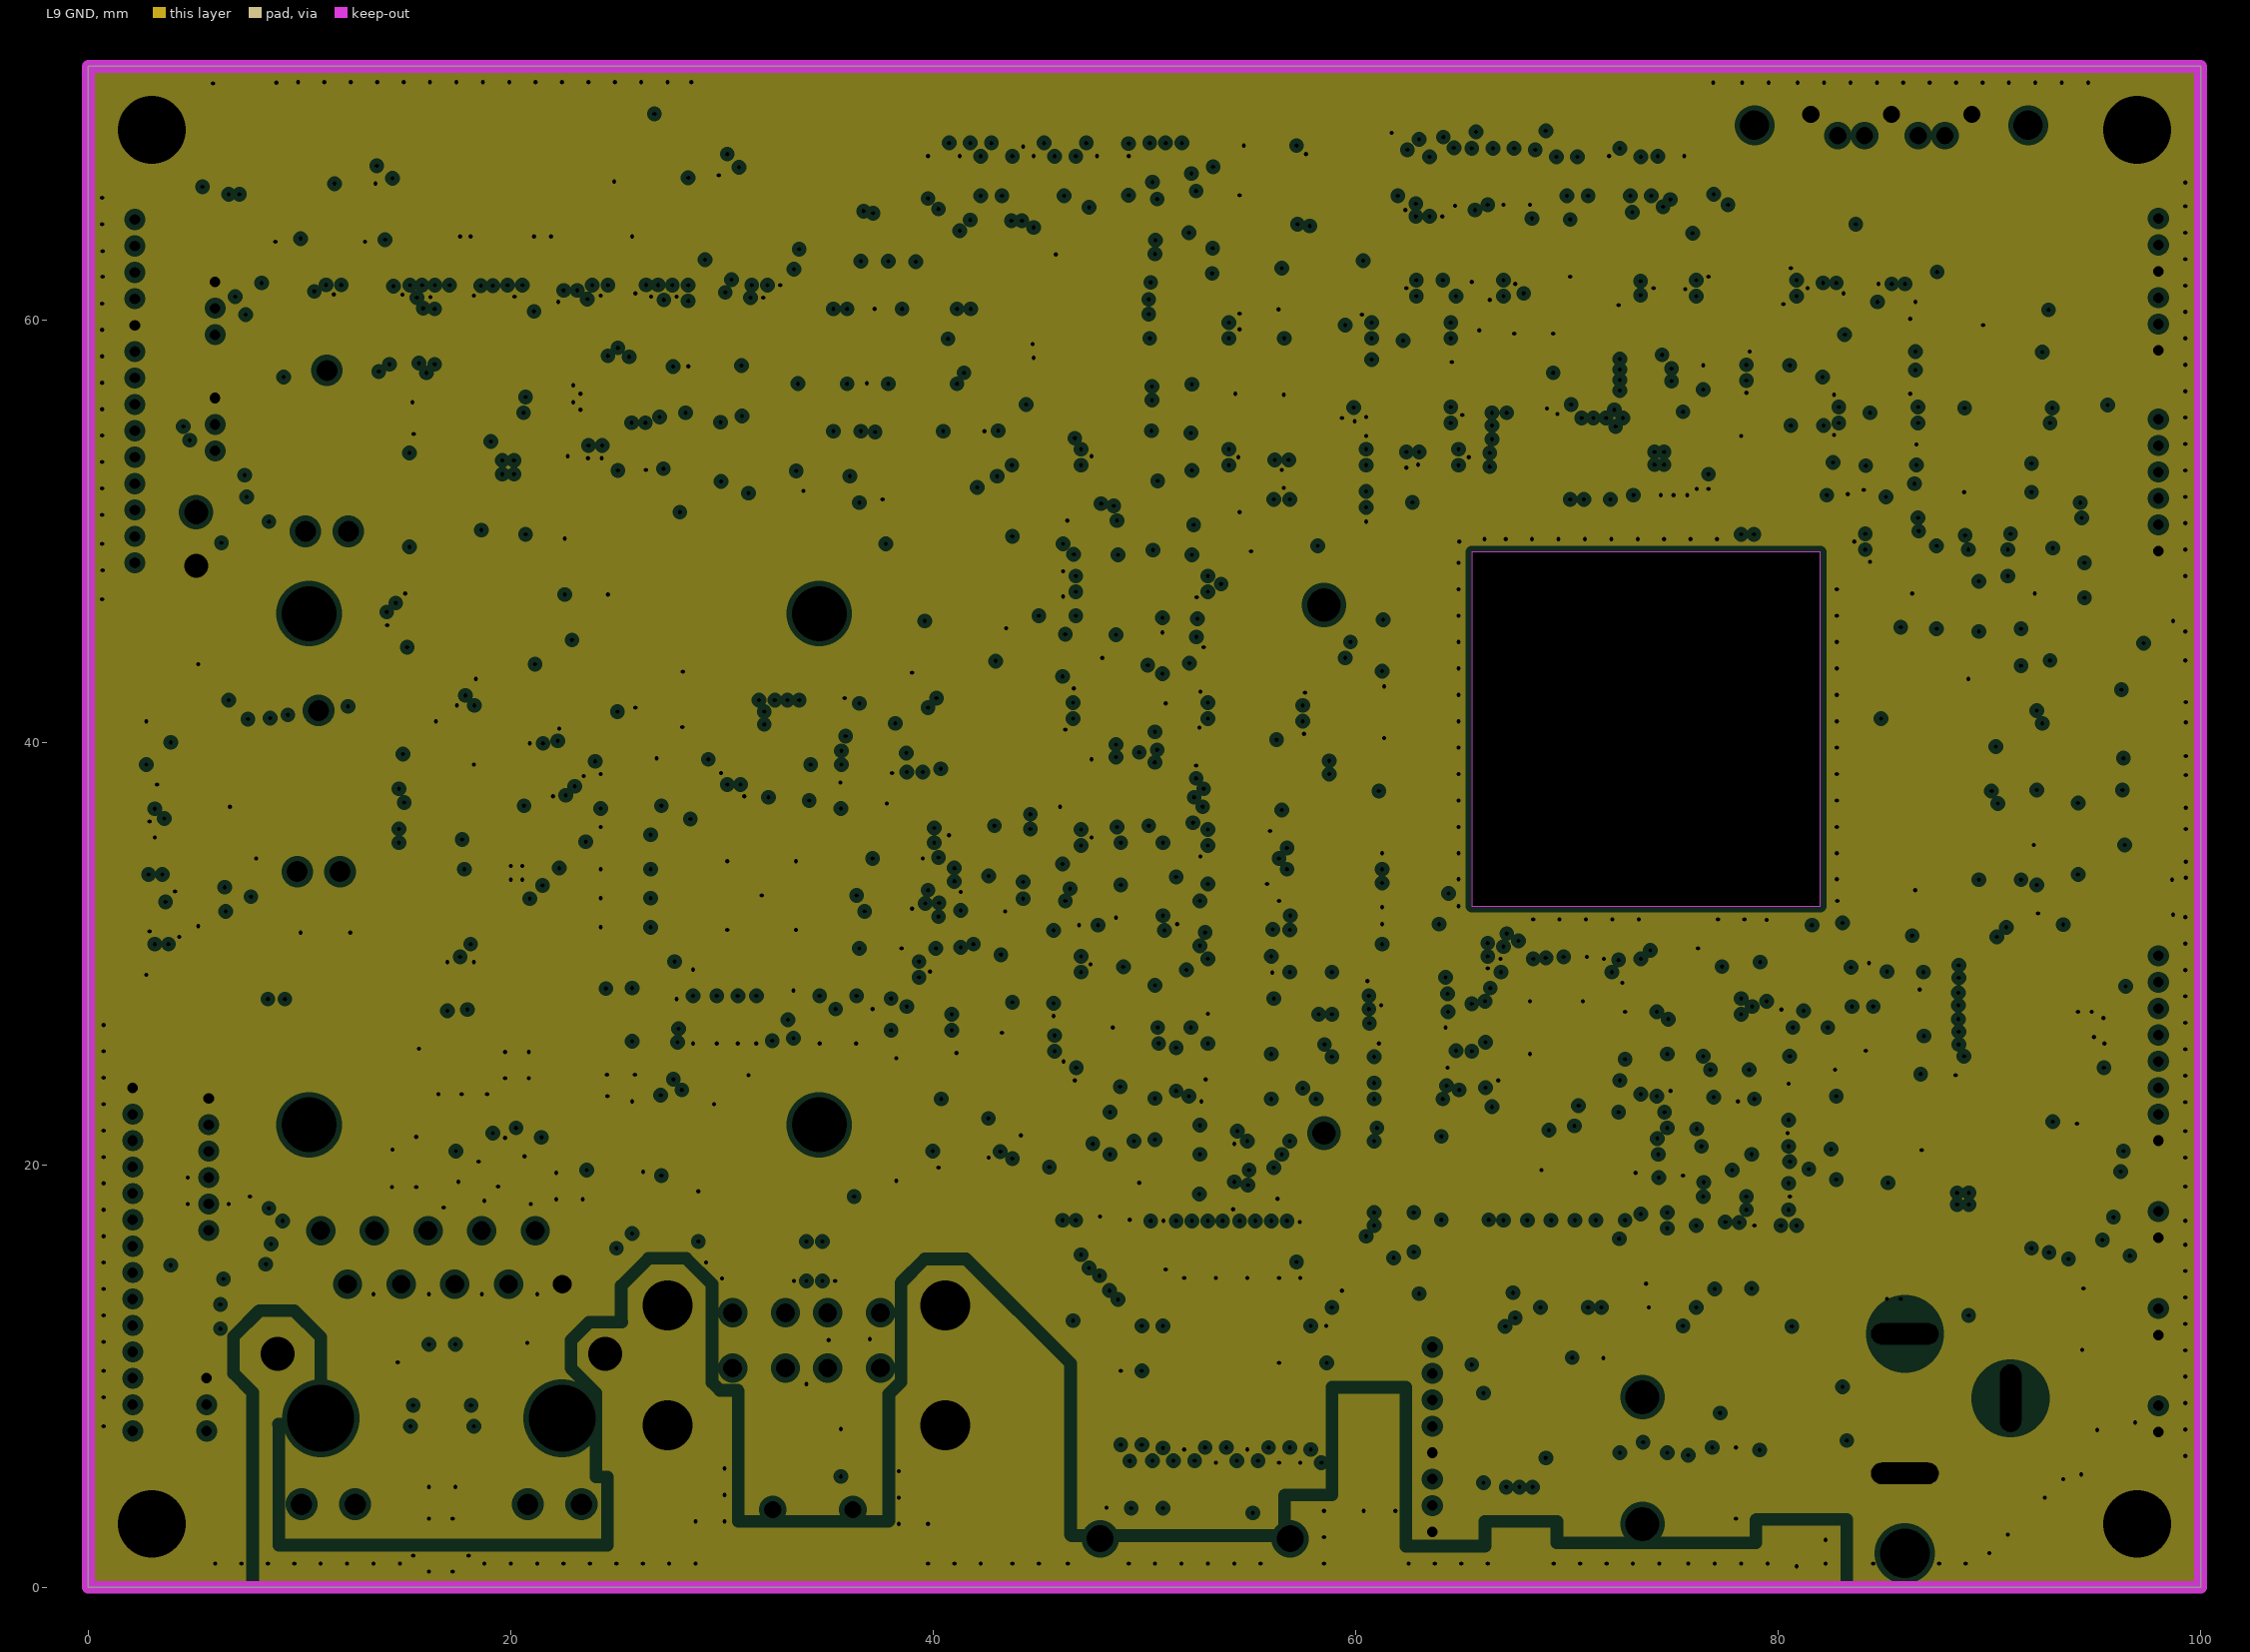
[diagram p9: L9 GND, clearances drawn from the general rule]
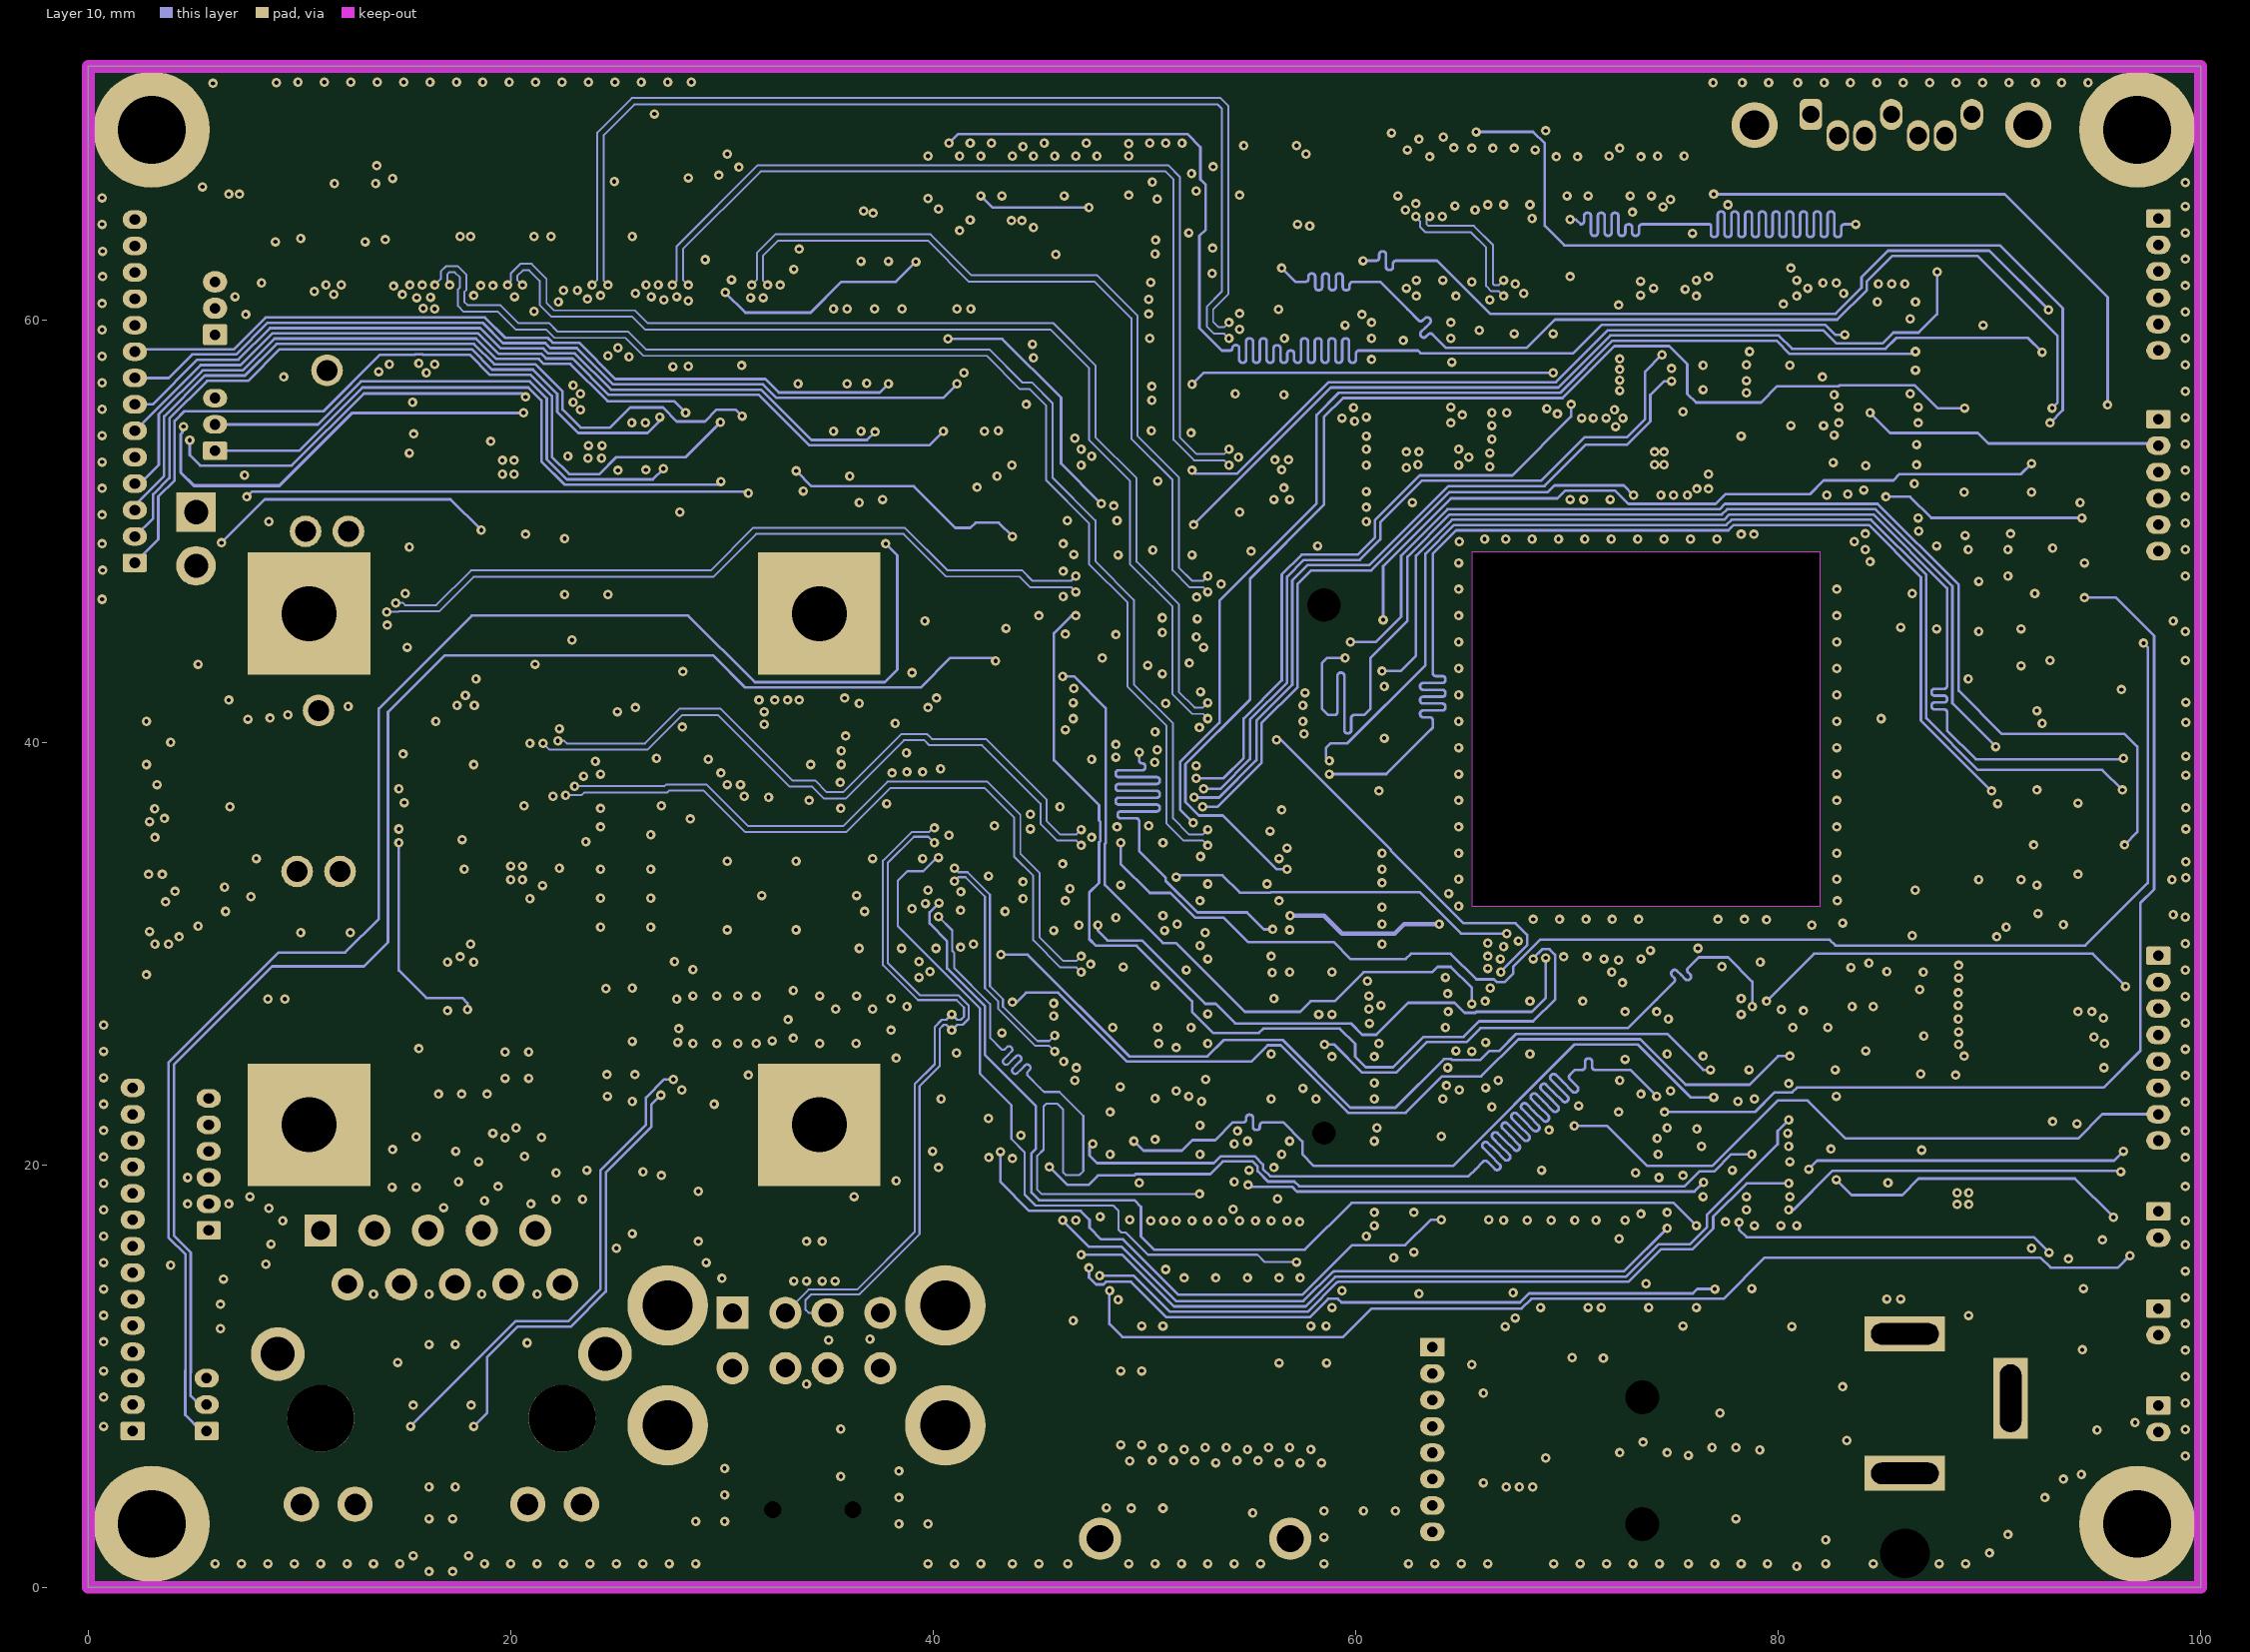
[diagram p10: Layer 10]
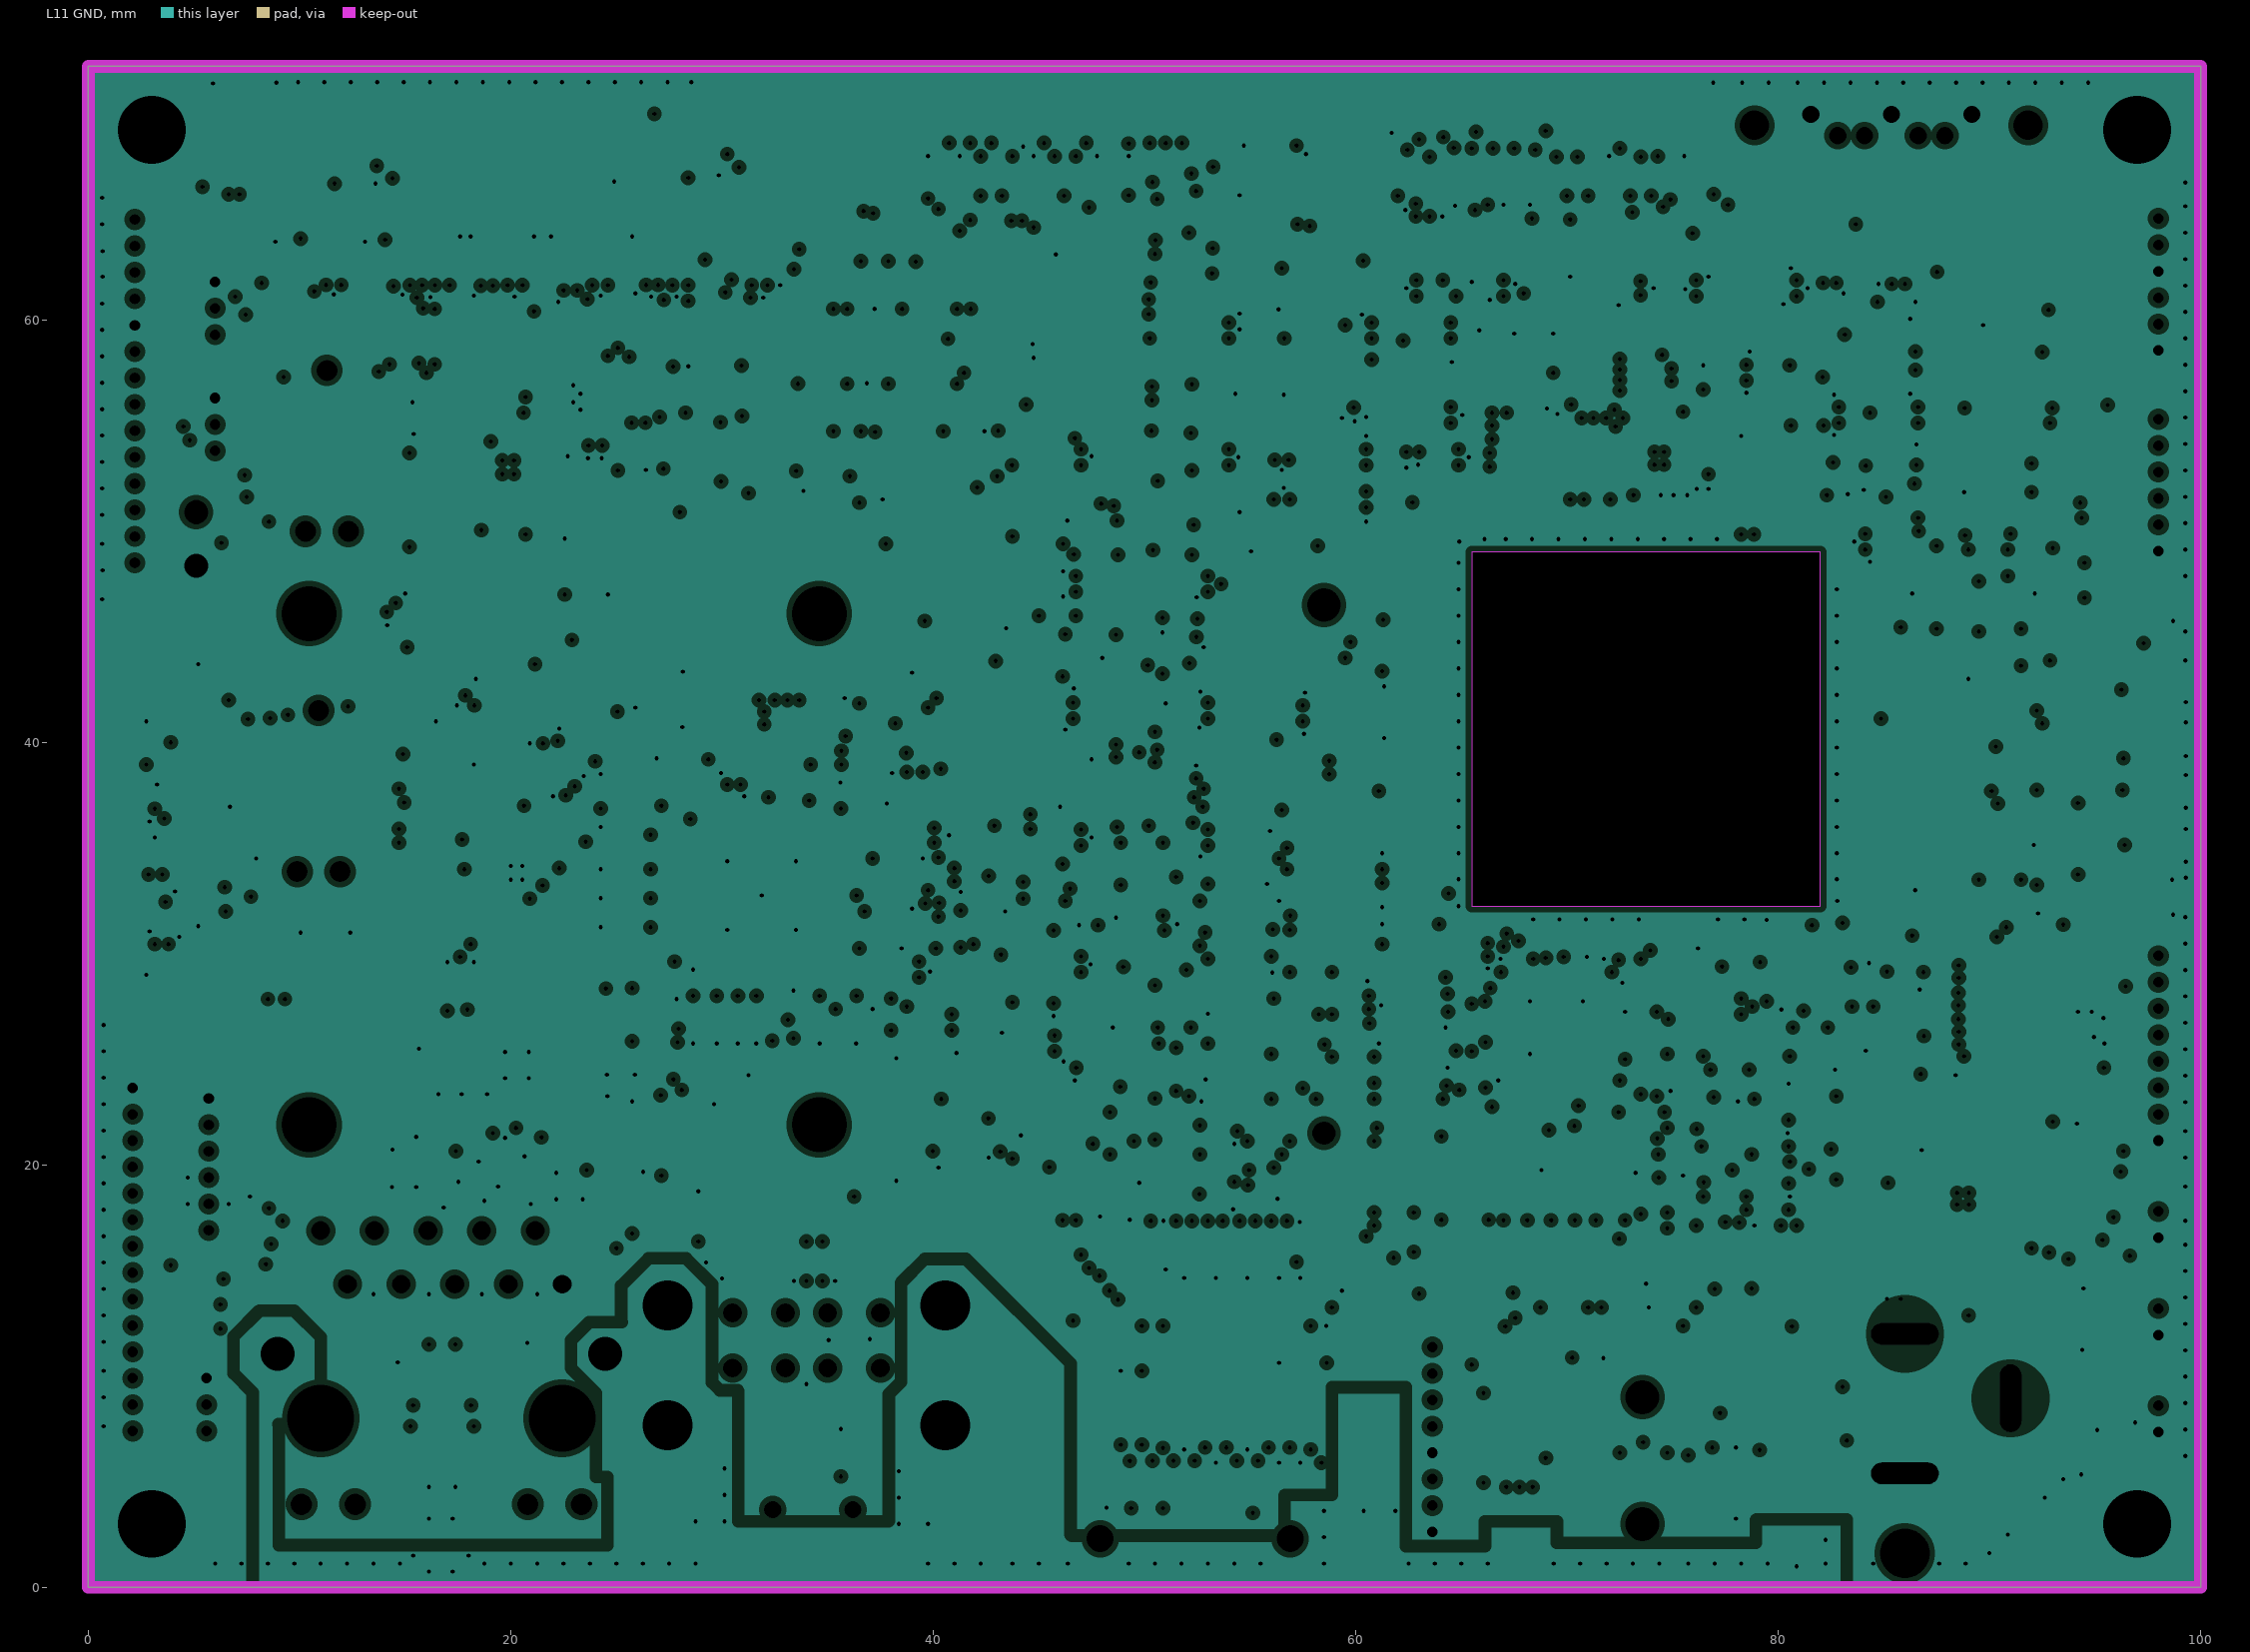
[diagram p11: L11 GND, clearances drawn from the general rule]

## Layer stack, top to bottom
Top Solder: solder mask 0.0127, Solder Resist, Dk 4.7
Top Layer: signal copper 0.051
Dielectric1: core 0.132, FR-4, Dk 4.02
L2 GND: plane copper 0.015, net GND
Dielectric10: prepreg 0.104, FR-4, Dk 4.2
Layer 3: signal copper 0.015
Dielectric7: core 0.141, FR-4, Dk 4.2
L4 GND: plane copper 0.015, net GND
Dielectric11: prepreg 0.104, FR-4, Dk 4.2
Layer 5: signal copper 0.015
Dielectric4: core 0.141, FR-4, Dk 4.2
L6 PWR: signal copper 0.015
Dielectric6: prepreg 0.104, FR-4, Dk 4.2
L7 3V3: plane copper 0.015, net 3V3
Dielectric2: core 0.141, FR-4, Dk 4.2
Layer 8: signal copper 0.015
Dielectric3: prepreg 0.104, FR-4, Dk 4.2
L9 GND: plane copper 0.015, net GND
Dielectric8: core 0.141, FR-4, Dk 4.2
Layer 10: signal copper 0.015
Dielectric5: prepreg 0.104, FR-4, Dk 4.2
L11 GND: plane copper 0.15, net GND
Dielectric9: core 0.132, FR-4, Dk 4.2
Bottom Layer: signal copper 0.051
Bottom Solder: solder mask 0.0127, Solder Resist, Dk 4.7

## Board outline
0,0 0,72 100,72 100,0
cut-out: 65.5,32.25 82,32.25 82,49 65.5,49

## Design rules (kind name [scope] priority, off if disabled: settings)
AssemblyTestPointUsage [All] p1 off: valid=2
AssemblyTestpoint [All] p1 off: testpointundercomponent=TRUE minsize=1.016 maxsize=2.54 preferedsize=1.524 minholesize=0 maxholesize=1.016 preferedholesize=0.813 testpointgrid=0.025 usegrid=TRUE gridtolerance=0 allowsidetop=TRUE allowsidebottom=TRUE
Clearance [Isvia vs Isvia] p1: gap=0 ignorepadtopadclearanceinfootprint=FALSE
Clearance "via to pad" [(iSPAD) AND NOT haspad ('U13-37','U10-49','U21-7','P1-M4','U17-33','U3-7','U20-7') vs iSVIA] p2: gap=0 ignorepadtopadclearanceinfootprint=FALSE
Clearance "L6 Clearance" [(InNamedPolygon('Polysolid_L6'))] p3 off: gap=0.25 ignorepadtopadclearanceinfootprint=FALSE except(0: Arc-Hole Track-Hole SMDPad-Hole THPad-Hole Via-Hole Fill-Hole Poly-Hole Region-Hole Text-Hole)
Clearance "diff pairs to everything" [(InDifferentialPairClass('All Differential Pairs'))] p4: gap=0.125 ignorepadtopadclearanceinfootprint=FALSE except(0: Arc-Hole Track-Hole SMDPad-Hole THPad-Hole Via-Hole Fill-Hole Poly-Hole Region-Hole Text-Hole)
Clearance "diff pairs to everything_1" [(InDifferentialPairClass('100_Ohms'))] p5: gap=0.133 ignorepadtopadclearanceinfootprint=FALSE except(0: Arc-Hole Track-Hole SMDPad-Hole THPad-Hole Via-Hole Fill-Hole Poly-Hole Region-Hole Text-Hole)
Clearance "Global Clearance" [All] p6: gap=0.125 ignorepadtopadclearanceinfootprint=FALSE except(0: Arc-Hole Track-Hole SMDPad-Hole THPad-Hole Via-Hole Fill-Hole Poly-Hole Region-Hole Text-Hole; 0.15: Track-SMDPad; 0.2: SMDPad-SMDPad)
Clearance "2.5mm thru hole to SMT" [IsPad and inSMTComponent and onBottom vs IsThruPin And InThruComponent  And Not InComponent ('J22') And Not InComponent ('P1') And Not InComponent ('J1') And Not InComponent ('J8')] p7: gap=2.5 ignorepadtopadclearanceinfootprint=FALSE except(0: Arc-Hole Track-Hole SMDPad-Hole THPad-Hole Via-Hole Fill-Hole Poly-Hole Region-Hole Text-Hole)
ComponentClearance [All] p1 off: gap=0.25 collisioncheckmode=3 verticalgap=0.25 showdistances=TRUE
DiffPairsRouting 85_Ohms [InDifferentialPairClass('85_Ohms')] p1: maxlimit=0.143 minlimit=0.125 mostfreqgap=0.125 toplayer_mingap=0.143 toplayer_prefgap=0.143 toplayer_minwidth=0.157 toplayer_maxwidth=0.157 toplayer_prefwidth=0.157 midlayer2_maxgap=0.125 midlayer2_minwidth=0.119 midlayer2_maxwidth=0.119 midlayer2_prefwidth=0.119 midlayer3_mingap=0 midlayer3_maxgap=0 midlayer3_prefgap=0 midlayer3_minwidth=0 midlayer3_maxwidth=0 midlayer3_prefwidth=0 midlayer4_maxgap=0.125 midlayer4_minwidth=0.119 midlayer4_maxwidth=0.119 midlayer4_prefwidth=0.119 midlayer5_mingap=0 midlayer5_maxgap=0 midlayer5_prefgap=0 midlayer5_minwidth=0.119 midlayer5_maxwidth=0.119 midlayer5_prefwidth=0.119 midlayer6_maxgap=0.125 midlayer6_minwidth=0.119 midlayer6_maxwidth=0.119 midlayer6_prefwidth=0.119 bottomlayer_mingap=0.143 bottomlayer_prefgap=0.143 bottomlayer_minwidth=0.157 bottomlayer_maxwidth=0.157 bottomlayer_prefwidth=0.157 maxuncoupledlength=100
DiffPairsRouting 90_Ohms [InDifferentialPairClass('90_Ohms')] p2: maxlimit=0.143 minlimit=0.128 mostfreqgap=0.128 toplayer_mingap=0.143 toplayer_prefgap=0.143 toplayer_minwidth=0.137 toplayer_maxwidth=0.137 toplayer_prefwidth=0.137 midlayer2_maxgap=0.128 midlayer2_minwidth=0 midlayer2_maxwidth=0 midlayer2_prefwidth=0 midlayer3_mingap=0 midlayer3_maxgap=0 midlayer3_prefgap=0 midlayer3_minwidth=0 midlayer3_maxwidth=0 midlayer3_prefwidth=0 midlayer4_maxgap=0.128 midlayer4_minwidth=0.103 midlayer4_maxwidth=0.103 midlayer4_prefwidth=0.103 midlayer5_mingap=0 midlayer5_maxgap=0 midlayer5_prefgap=0 midlayer5_minwidth=0.103 midlayer5_maxwidth=0.103 midlayer5_prefwidth=0.103 midlayer6_maxgap=0.128 midlayer6_minwidth=0.103 midlayer6_maxwidth=0.103 midlayer6_prefwidth=0.103 bottomlayer_mingap=0.143 bottomlayer_prefgap=0.143 bottomlayer_minwidth=0.137 bottomlayer_maxwidth=0.137 bottomlayer_prefwidth=0.137 maxuncoupledlength=100
DiffPairsRouting 100_Ohms [InDifferentialPairClass('100_Ohms')] p3: maxlimit=0.207 minlimit=0.151 mostfreqgap=0.207 toplayer_maxgap=0.151 toplayer_prefgap=0.151 toplayer_minwidth=0.104 toplayer_maxwidth=0.104 toplayer_prefwidth=0.104 midlayer2_mingap=0.207 midlayer2_minwidth=0.093 midlayer2_maxwidth=0.093 midlayer2_prefwidth=0.093 midlayer3_mingap=0.207 midlayer3_minwidth=0.093 midlayer3_maxwidth=0.093 midlayer3_prefwidth=0.093 midlayer4_mingap=0.207 midlayer4_minwidth=0.093 midlayer4_maxwidth=0.093 midlayer4_prefwidth=0.093 midlayer5_mingap=0 midlayer5_maxgap=0 midlayer5_prefgap=0 midlayer5_minwidth=0.093 midlayer5_maxwidth=0.093 midlayer5_prefwidth=0.093 midlayer6_mingap=0.207 midlayer6_minwidth=0.093 midlayer6_maxwidth=0.093 midlayer6_prefwidth=0.093 bottomlayer_maxgap=0.151 bottomlayer_prefgap=0.151 bottomlayer_minwidth=0.104 bottomlayer_maxwidth=0.104 bottomlayer_prefwidth=0.104 maxuncoupledlength=100
FabricationTestPointUsage TestPointUsage [All] p1 off: valid=2 allowmultiple=FALSE
FabricationTestpoint Testpoint [All] p1 off: side=3 testpointundercomponent=TRUE minsize=1.016 maxsize=2.54 preferedsize=1.524 minholesize=0 maxholesize=1.016 preferedholesize=0.813 testpointgrid=0.025 allowsidetop=TRUE allowsidebottom=TRUE usegrid=TRUE gridtolerance=0
HoleSize [All] p1: absolutevalues=TRUE maxlimit=6 minlimit=0.15 maxpercent=80.000 minpercent=20.000
HoleToHoleClearance [All] p1: gap=0.25 allowstackedmicrovias=TRUE
MatchedLengths MatchedLengths_SD2 [InxSignalClass('SD2')] p1: tolerance=0.1 checknetsindiffpair=FALSE checkdiffpairvsdiffpair=TRUE checkxsignals=TRUE checkothers=TRUE
MatchedLengths MatchedLengths_CSI-DAT [InxSignalClass('CSI_DAT')] p2: tolerance=0.1 checknetsindiffpair=FALSE checkdiffpairvsdiffpair=TRUE checkxsignals=TRUE checkothers=TRUE
MatchedLengths MatchedLengths_RGMII_R [InxSignalClass('RGMII_R')] p3: tolerance=0.1 checknetsindiffpair=FALSE checkdiffpairvsdiffpair=TRUE checkxsignals=TRUE checkothers=TRUE
MatchedLengths MatchedLengths_RGMII_T [InxSignalClass('RGMII_T')] p4: tolerance=0.1 checknetsindiffpair=FALSE checkdiffpairvsdiffpair=TRUE checkxsignals=TRUE checkothers=TRUE
MinimumAnnularRing "No Plating" [Not PadIsPlated] p1: minimumring=0
MinimumAnnularRing [All] p2: minimumring=0.1
MinimumSolderMaskSliver [All] p1 off: minsoldermaskwidth=0.1
PlaneClearance "3V3 PlaneClearance" [(InNamedPolygon('Layer 7 3V3'))] p1: clearance=0.25
PlaneClearance [All] p2: clearance=0.25
PlaneConnect "Via_ Direct_Connect_to_Plane" [IsVia] p1: planeconnectstyle=Direct reliefexpansion=0.508 reliefentries=4 reliefconductorwidth=0.254 reliefairgap=0.254
PlaneConnect [All] p2: planeconnectstyle=Relief reliefexpansion=0.2 reliefentries=4 reliefconductorwidth=0.25 reliefairgap=0.2
PolygonConnect Polysolid [All vs IsnamedPolygon('Polysolid','Polysolid_L6')] p1: connectstyle=Direct reliefconductorwidth=0.254 reliefentries=4 polygonreliefangle="90 Angle" airgapwidth=0.254
PolygonConnect "Polygon To Via" [IsVia] p2: connectstyle=Direct reliefconductorwidth=0.254 reliefentries=4 polygonreliefangle="90 Angle" airgapwidth=0.254
PolygonConnect [All] p3: connectstyle=Relief reliefconductorwidth=0.25 reliefentries=4 polygonreliefangle="90 Angle" airgapwidth=0.2
RoutingCorners [All] p1: cornerstyle=45-Degree minsetback=2 maxsetback=2
RoutingLayers RoutingLayers_DSI_CLK0 [InNet('DSI_CLK0_N') or InNet('DSI_CLK0_P')] p1: top layer_v5=TRUE mid layer 2_v5=TRUE mid layer 3_v5=TRUE mid layer 4_v5=TRUE mid layer 5_v5=FALSE mid layer 6_v5=TRUE bottom layer_v5=TRUE
RoutingLayers RoutingLayers_Power [InNetClass('Power')] p2: top layer_v5=TRUE mid layer 2_v5=TRUE mid layer 3_v5=TRUE mid layer 4_v5=TRUE mid layer 5_v5=TRUE mid layer 6_v5=TRUE bottom layer_v5=TRUE
RoutingLayers RoutingLayers_50_Ohms [InNetClass('50_Ohm')] p3: top layer_v5=TRUE mid layer 2_v5=TRUE mid layer 3_v5=FALSE mid layer 4_v5=TRUE mid layer 5_v5=FALSE mid layer 6_v5=TRUE bottom layer_v5=TRUE
RoutingLayers RoutingLayers_GND [InNetClass('GND')] p4: top layer_v5=TRUE mid layer 2_v5=TRUE mid layer 3_v5=TRUE mid layer 4_v5=TRUE mid layer 5_v5=FALSE mid layer 6_v5=TRUE bottom layer_v5=TRUE
RoutingLayers "RoutingLayers_100_Ohm Diff Pairs" [InDifferentialPairClass ('100_Ohms')] p5: top layer_v5=TRUE mid layer 2_v5=TRUE mid layer 3_v5=TRUE mid layer 4_v5=TRUE mid layer 5_v5=FALSE mid layer 6_v5=TRUE bottom layer_v5=TRUE
RoutingLayers "RoutingLayers_90_Ohm Diff Pairs" [InDifferentialPairClass ('90_Ohms')] p6: top layer_v5=TRUE mid layer 2_v5=TRUE mid layer 3_v5=FALSE mid layer 4_v5=TRUE mid layer 5_v5=FALSE mid layer 6_v5=TRUE bottom layer_v5=TRUE
RoutingLayers "RoutingLayers_85_Ohm Diff Pairs" [InDifferentialPairClass ('85_Ohms')] p7: top layer_v5=TRUE mid layer 2_v5=TRUE mid layer 3_v5=FALSE mid layer 4_v5=TRUE mid layer 5_v5=FALSE mid layer 6_v5=TRUE bottom layer_v5=TRUE
RoutingLayers [All] p8: top layer_v5=TRUE mid layer 2_v5=TRUE mid layer 3_v5=TRUE mid layer 4_v5=TRUE mid layer 5_v5=TRUE mid layer 6_v5=TRUE bottom layer_v5=TRUE
RoutingVias [All] p1: holewidth=0.2 width=0.45 viastyle="Through Hole" minholewidth=0.2 minwidth=0.45 maxholewidth=0.2 maxwidth=0.45
SMDNeckDown [All] p1: percent=100.000
SilkToBoardRegionClearance [All] p1 off:
SilkToSilkClearance [All] p1 off: silktosilkclearance=0.125
SilkToSolderMaskClearance SilkscreenOverComponentPads [IsPad] p1 off: minsilkscreentomaskgap=0.125 clearancetoexposedcopper=TRUE
SolderMaskExpansion "Feedthru Via" [IsVia] p1: expansion=-0.025
SolderMaskExpansion "SolderMaskExpansion_FCI Headers" [HasFootprint('FCI_68002-102HLF')] p2 off: expansion=2.5
SolderMaskExpansion SolderMaskExpansion_Xbee [HasFootprint('SAMTEC_MMS-110-01-L-SV')] p3 off: expansion=2.5
SolderMaskExpansion SolderMaskExpansion_USB [HasFootprint('KYCON_KUSBX-AS2N')] p4 off: expansion=2.5
SolderMaskExpansion SolderMaskExpansion_Ethernet [HasFootprint('BELFUSE_61001-F')] p5 off: expansion=2.5
SolderMaskExpansion [All] p6: expansion=0.05
Width "Width 100_Ohms" [InDifferentialPairClass('100_Ohms')] p1: maxlimit=0.104 minlimit=0.093 preferedwidth=0.093 toplayer_minwidth=0.104 toplayer_prefwidth=0.104 midlayer2_maxwidth=0.093 midlayer3_maxwidth=0.093 midlayer4_maxwidth=0.093 midlayer5_minwidth=0 midlayer5_maxwidth=0 midlayer5_prefwidth=0 midlayer6_maxwidth=0.093 bottomlayer_minwidth=0.104 bottomlayer_prefwidth=0.104 minimp=50.000000 maximp=50.000000 favimp=50.000000 checkconnectedcopper=TRUE
Width "Width 90_Ohms" [InDifferentialPairClass('90_Ohms')] p2: maxlimit=0.137 minlimit=0.103 preferedwidth=0.103 toplayer_minwidth=0.137 toplayer_prefwidth=0.137 midlayer2_maxwidth=0.103 midlayer3_minwidth=0 midlayer3_maxwidth=0 midlayer3_prefwidth=0 midlayer4_maxwidth=0.103 midlayer5_minwidth=0 midlayer5_maxwidth=0 midlayer5_prefwidth=0 midlayer6_maxwidth=0.103 bottomlayer_minwidth=0.137 bottomlayer_prefwidth=0.137 minimp=50.000000 maximp=50.000000 favimp=50.000000 checkconnectedcopper=TRUE
Width "Width 85_Ohms" [InDifferentialPairClass('85_Ohms')] p3: maxlimit=0.157 minlimit=0.119 preferedwidth=0.119 toplayer_minwidth=0.157 toplayer_prefwidth=0.157 midlayer2_maxwidth=0.119 midlayer3_minwidth=0 midlayer3_maxwidth=0 midlayer3_prefwidth=0 midlayer4_maxwidth=0.119 midlayer5_minwidth=0 midlayer5_maxwidth=0 midlayer5_prefwidth=0 midlayer6_maxwidth=0.119 bottomlayer_minwidth=0.157 bottomlayer_prefwidth=0.157 minimp=50.000000 maximp=50.000000 favimp=50.000000 checkconnectedcopper=TRUE
Width "Width 50_Ohms" [InNetClass('50_Ohms')] p4: maxlimit=0.2 minlimit=0.103 preferedwidth=0.103 toplayer_minwidth=0.2 toplayer_prefwidth=0.2 midlayer2_maxwidth=0.103 midlayer3_minwidth=0 midlayer3_maxwidth=0 midlayer3_prefwidth=0 midlayer4_maxwidth=0.103 midlayer5_minwidth=0 midlayer5_maxwidth=0 midlayer5_prefwidth=0 midlayer6_maxwidth=0.103 bottomlayer_minwidth=0.2 bottomlayer_prefwidth=0.2 minimp=50.000000 maximp=50.000000 favimp=50.000000
Width "Width Power" [InNetClass('Power')] p5: maxlimit=1 minlimit=0.125 preferedwidth=0.25
Width "Width GND" [InNetClass('GND')] p6: maxlimit=1 minlimit=0.125 preferedwidth=0.3 toplayer_prefwidth=0.25 midlayer4_prefwidth=0.25 midlayer5_prefwidth=0.25 midlayer6_prefwidth=0.25 bottomlayer_prefwidth=0.25 minimp=50.000000 maximp=50.000000 favimp=50.000000
Width [All] p7: maxlimit=0.5 minlimit=0.1 preferedwidth=0.125
14 further rules are at their usual default settings.

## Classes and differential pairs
net class CSI_DAT: CSI1_DAT12 CSI1_DAT13 CSI1_DAT14 CSI1_DAT15 CSI1_DAT16 CSI1_DAT17 CSI1_DAT18 CSI1_DAT19
net class RGMII_T: RGMII_TD0 RGMII_TD1 RGMII_TD2 RGMII_TD3 RGMII_TX_CTL RGMII_TXC
net class RGMII_R: RGMII_RD0 RGMII_RD1 RGMII_RD2 RGMII_RD3 RGMII_RX_CTL RGMII_RXC
net class RGMII: NetC104_2 NetR48_2 RGMII_1V2 RGMII_INT_N RGMII_MDC RGMII_MDIO RGMII_RD0 RGMII_RD1 RGMII_RD2 RGMII_RD3 RGMII_REF_CLK RGMII_RESET_N RGMII_RX_CTL RGMII_RXC RGMII_TD0 RGMII_TD1 RGMII_TD2 RGMII_TD3 RGMII_TX_CTL RGMII_TXC
net class Clocks: AUD_CLK CSI0_MCLK CSI0_PIXCLK CSI1_MCLK CSI1_PIXCLK DISP0_CLK MCA_SWD_CLK NetJ7_5 NetR48_2 PCIE_UIM_CLK RGMII_REF_CLK SD2_CLK SPI1_CLK
component class Connectors: J1 J2 J3 J4 J5 J7 J8 J9 J10 J11 J13 J14 J15 J16 J17 J19 J21 J22 J23 J24 J25 J26 J27 J28 J29 J30 J31 J32 J33 J34 P1
differential pair class 85_Ohms: CLK1 PCIE_RX PCIE_TX PCIECLK PCIERX PCIETX
differential pair class 90_Ohms: OTGD USB_OTG_D USBH1_D USBH2_D USBH3_D USBH4_D USBH_D XBEE_USB
differential pair class 100_Ohms: CSI_CLK0 CSI_D0 CSI_D1 DSI_CLK0 DSI_D0 DSI_D1 ETH_TXRXA ETH_TXRXB ETH_TXRXC ETH_TXRXD HDMI_CLK HDMI_D0 HDMI_D1 HDMI_D2 LVDS0_CLK LVDS0_TX0 LVDS0_TX1 LVDS0_TX2 LVDS0_TX3 LVDS1_CLK LVDS1_TX0 LVDS1_TX1 LVDS1_TX2 LVDS1_TX3 SATA_RX SATA_TX SATARX SATATX
component class "11 - Expansion Connectors, User LEDs": D4 D5 D6 J26 J27 J28 J29 J30 J32 J34 R117 R119 R120 R121 R122 R204 R205 R206 R257 R258 R259
component class "10 - CAN, I2C, XBee": C99 C100 C101 C114 D11 J23 J24 J25 L28 L29 Q5 R84 R95 R96 R97 R98 R99 R100 R101 R102 R103 R104 R105 R106 R107 R108 R109 R110 R111 R112 R113 R114 R115 R116 R129 R130 R133 R134 R135 R136 R145 R146 R155 R156 R207 R208 R298 R299 U18 U19
component class "09 - Audio": C87 C88 C89 C90 C91 C92 C93 C94 C95 C96 C97 C98 C102 C103 C118 D7 D8 D9 J22 L18 L19 L20 L21 L22 L23 L24 L25 L26 L27 Q4 R91 R92 R93 R94 R128 R131 R132 U17 U22
component class "08 - Displays, HDMI, Cameras": C80 C81 C82 C83 C84 C85 C86 C105 C106 D3 J17 J18 J19 J21 J31 J33 L30 L31 L32 L33 L34 L35 L36 L37 L38 L39 L40 L41 L42 L43 L44 L45 P1 P18 P20 R76 R78 R85 R86 R87 R88 R89 R90 R118 U16
component class "07 - USB OTG, USB HUB, USB Host": C62 C63 C64 C65 C66 C67 C68 C69 C70 C71 C72 C73 C74 C75 C76 C77 C78 C79 D10 J15 J16 L6 L7 L8 L9 L10 L11 L12 L13 L14 L15 L16 L17 Q2 R64 R65 R66 R67 R68 R69 R70 R71 R72 R73 R74 R75 U12 U13 U14 U15 U20 U21 X2
component class "06 - Gigabit Ethernet": C28 C29 C30 C33 C42 C43 C44 C45 C46 C47 C48 C49 C50 C51 C52 C53 C54 C55 C56 C57 C58 C59 C60 C61 C104 J13 L2 L3 L4 L5 R26 R27 R38 R39 R40 R41 R45 R46 R48 R49 R50 R53 R54 R55 R56 R57 R58 R59 R60 R61 R62 R63 R154 U10 U11 X1
component class "05 - JTAG, SWD, Console, UART": C18 C19 C20 C21 C22 C23 C24 C25 C26 C27 CAD1 CAD2 J9 J10 J11 R36 R37 R127 R149 R150 R151 R152 U8 U9
component class "03 - Power, boot strap, reset": C1 C2 C3 C4 C5 C6 C7 C8 C9 C10 C11 D1 D2 FIL1 J1 J2 J3 J4 J5 Q1 Q3 R6 R7 R8 R9 R10 R11 R12 R13 R14 R15 R16 R17 R18 R19 R21 R22 R24 R25 R28 R29 R77 R123 R125 R126 R147 R148 SW1 SW2 SW3 U2 U3 U4 U5 U6 U7
component class "02 - CCIMX6 Module": R1 R2 R3 R4 R5 R20 R23 R80 R81 R82 R83 R153 TP1 TP2 U1
component class "04 - SATA, microSD, Mini PCIe, microSIM": C12 C13 C14 C15 C16 C17 C31 C32 C34 C35 C36 C37 C38 C39 C40 C41 C107 C108 C109 C110 C111 C112 C113 C115 C116 C117 C119 J7 J8 J12 J14 L1 R30 R31 R32 R33 R34 R35 R42 R43 R44 R47 R51 R52 R137 R138 R139 R140 R141 R142 R143 R144 U23
component class IC's: Q1 Q2 SW1 U1 U2 U3 U4 U5 U6 U7 U8 U9 U10 U11 U12 U13 U14 U15 U16 U17 U18 U19 X1 X2
net class Power: 3V3 5V NetC42_2 NetC46_2 NetC50_2 NetC72_2 NetR6_2 RGMII_1V2 VCC_LICELL VIN VLDO3_MCA VLDO4_2V5 VLDO6_1V5
net class GND: AGND GND SHLD
net class 50_Ohms: NetJ7_5 NetR48_2 RGMII_RD0 RGMII_RD1 RGMII_RD2 RGMII_RD3 RGMII_REF_CLK RGMII_RX_CTL RGMII_RXC RGMII_TD0 RGMII_TD1 RGMII_TD2 RGMII_TD3 RGMII_TX_CTL RGMII_TXC SD2_CLK SD2_CMD SD2_DAT0 SD2_DAT1 SD2_DAT2 SD2_DAT3
component class "13 - History, Mechanicals": FIDUCIAL1 FIDUCIAL2 FIDUCIAL3 FIDUCIAL4 FIDUCIAL5 FIDUCIAL6 FIDUCIAL11 FIDUCIAL12 FIDUCIAL13 FIDUCIAL14 H1 H2 H3 H4 LBL1 PCB1
net class SD2: NetJ7_5 SD2_CLK SD2_CMD SD2_DAT0 SD2_DAT1 SD2_DAT2 SD2_DAT3
net class "micro SIM": PCIE_UIM_CLK PCIE_UIM_DATA PCIE_UIM_PWR PCIE_UIM_RST PCIE_UIM_VPP
net class CSI0: CSI0_DAT12 CSI0_DAT13 CSI0_DAT14 CSI0_DAT15 CSI0_DAT16 CSI0_DAT17 CSI0_DAT18 CSI0_DAT19 CSI0_GPIO CSI0_HSYNC CSI0_I2C_SCL CSI0_I2C_SDA CSI0_MCLK CSI0_PIXCLK CSI0_RESET_N CSI0_VSYNC
net class CSI1: CSI1_DAT12 CSI1_DAT13 CSI1_DAT14 CSI1_DAT15 CSI1_DAT16 CSI1_DAT17 CSI1_DAT18 CSI1_DAT19 CSI1_GPIO CSI1_HSYNC CSI1_HSYNC/BTCFG2_3 CSI1_I2C_SCL CSI1_I2C_SDA CSI1_MCLK CSI1_PIXCLK CSI1_RESET_N CSI1_VSYNC CSI1_VSYNC/BTCFG2_4
net class CSI: CSI_CLK0_N CSI_CLK0_P CSI_D0_N CSI_D0_P CSI_D1_N CSI_D1_P CSI_I2C_SCL CSI_I2C_SDA CSI_RESET_N
differential pair USBH2_D: +USBH2_D_P -USBH2_D_N
differential pair USBH3_D: +USBH3_D_P -USBH3_D_N
differential pair USBH4_D: +USBH4_D_P -USBH4_D_N
differential pair OTGD: +OTGD_P -OTGD_N
differential pair USBH_D: +USBH_D_P -USBH_D_N
differential pair USBH1_D: +USBH1_D_P -USBH1_D_N
differential pair USB_OTG_D: +USB_OTG_D_P -USB_OTG_D_N
differential pair SATATX: +SATATX_P -SATATX_N
differential pair SATARX: +SATARX_P -SATARX_N
differential pair SATA_TX: +SATA_TX_P -SATA_TX_N
differential pair SATA_RX: +SATA_RX_P -SATA_RX_N
differential pair PCIETX: +PCIETX_P -PCIETX_N
differential pair PCIERX: +PCIERX_P -PCIERX_N
differential pair PCIECLK: +PCIECLK_P -PCIECLK_N
differential pair PCIE_TX: +PCIE_TX_P -PCIE_TX_N
differential pair PCIE_RX: +PCIE_RX_P -PCIE_RX_N
differential pair LVDS1_TX3: +LVDS1_TX3_P -LVDS1_TX3_N
differential pair LVDS1_TX2: +LVDS1_TX2_P -LVDS1_TX2_N
differential pair LVDS1_TX1: +LVDS1_TX1_P -LVDS1_TX1_N
differential pair LVDS1_TX0: +LVDS1_TX0_P -LVDS1_TX0_N
differential pair LVDS1_CLK: +LVDS1_CLK_P -LVDS1_CLK_N
differential pair LVDS0_TX3: +LVDS0_TX3_P -LVDS0_TX3_N
differential pair LVDS0_TX2: +LVDS0_TX2_P -LVDS0_TX2_N
differential pair LVDS0_TX1: +LVDS0_TX1_P -LVDS0_TX1_N
differential pair LVDS0_TX0: +LVDS0_TX0_P -LVDS0_TX0_N
differential pair LVDS0_CLK: +LVDS0_CLK_P -LVDS0_CLK_N
differential pair HDMI_D2: +HDMI_D2_P -HDMI_D2_N
differential pair HDMI_D1: +HDMI_D1_P -HDMI_D1_N
differential pair HDMI_D0: +HDMI_D0_P -HDMI_D0_N
differential pair HDMI_CLK: +HDMI_CLK_P -HDMI_CLK_N
differential pair ETH_TXRXD: +ETH_TXRXD_P -ETH_TXRXD_N
differential pair ETH_TXRXC: +ETH_TXRXC_P -ETH_TXRXC_N
differential pair ETH_TXRXB: +ETH_TXRXB_P -ETH_TXRXB_N
differential pair ETH_TXRXA: +ETH_TXRXA_P -ETH_TXRXA_N
differential pair DSI_D1: +DSI_D1_P -DSI_D1_N
differential pair DSI_D0: +DSI_D0_P -DSI_D0_N
differential pair DSI_CLK0: +DSI_CLK0_P -DSI_CLK0_N
differential pair CSI_D1: +CSI_D1_P -CSI_D1_N
differential pair CSI_D0: +CSI_D0_P -CSI_D0_N
differential pair CSI_CLK0: +CSI_CLK0_P -CSI_CLK0_N
differential pair CLK1: +CLK1_P -CLK1_N
differential pair XBEE_USB: +XBEE_USB_P -XBEE_USB_N

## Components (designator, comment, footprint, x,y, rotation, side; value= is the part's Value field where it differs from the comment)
C1 "100uF" CAPMP3216X120N 92.32,25.5 r0 bottom
C2 "10uF" CAPC1005X55N#1 92.17,23.75 r180 bottom
C3 "1.0UF" CAPC1005X55N#1 90.07,23.75 r0 bottom
C4 "100nF" CAPC1005X55N#1 81.5,24.5 r180 bottom
C5 "100nF" CAPC1005X55N#1 75.5,24.5 r90 bottom
C6 "100nF" CAPC1005X55N#1 75.5,22.5 r270 bottom
C7 "100nF" CAPC1005X55N#1 75.5,18.5 r270 bottom
C8 "22µF" CAPC1608X90N#1 43.9,60.15 r180 bottom
C9 "100uF" CAPMP3216X120N 44.4,61.85 r0 bottom
C10 "100nF" CAPC1005X55N#1 43.5,58.95 r180 bottom
C11 "10uF" CAPC1005X55N#1 44.65,57.1 r270 bottom
C12 "10uF" CAPC1005X55N#1 75,13.25 r0 top
C13 "100nF" CAPC1005X55N#1 72.75,13.25 r180 top
C14 ".01uF" CAPC1005X55N#1 81.875,62.875 r90 bottom
C15 ".01uF" CAPC1005X55N#1 83,62.875 r90 bottom
C16 ".01uF" CAPC1005X55N#1 85.125,62.875 r90 bottom
C17 ".01uF" CAPC1005X55N#1 86.25,62.875 r90 bottom
C18 "100nF" CAPC1005X55N#1 26.6,60 r180 bottom
C19 "100nF" CAPC1005X55N#1 26.65,58.3 r0 bottom
C20 "100nF" CAPC1005X55N#1 38.05,61.65 r270 bottom
C21 "100nF" CAPC1005X55N#1 35.75,61.65 r90 bottom
C22 "100nF" CAPC1005X55N#1 25.075,54 r270 bottom
C23 "100nF" CAPC1005X55N#1 35.6,55.85 r270 bottom
C24 "100nF" CAPC1005X55N#1 26.4,54 r90 bottom
C25 "100nF" CAPC1005X55N#1 36.85,55.85 r270 bottom
C26 "100nF" CAPC1005X55N#1 28.2,59.65 r90 bottom
C27 "100nF" CAPC1005X55N#1 36.9,61.65 r90 bottom
C28 "22pF" CAPC1005X55N#1 26.625,41.35 r270 top
C29 "100nF" CAPC1005X55N#1 7.65,17.325 r270 top
C30 "22pF" CAPC1005X55N#1 29.35,43.05 r0 top
C31 "100nF" CAPC1005X55N#1 57.5,52.5 r270 bottom
C32 "100nF" CAPC1005X55N#1 55.5,52.5 r270 bottom
C33 "100nF" CAPC1005X55N#1 17.25,2 r90 bottom
C34 "100uF" CAPMP3216X120N 49.75,18.5 r180 bottom
C35 "100uF" CAPMP3216X120N 48.5,36.95 r180 bottom
C36 "100uF" CAPMP3216X120N 59.4,52.3 r90 bottom
C37 "100nF" CAPC1005X55N#1 51.5,44.5 r0 bottom
C38 "100nF" CAPC1005X55N#1 50.625,16.125 r90 bottom
C39 "100nF" CAPC1005X55N#1 49.55,38.55 r0 bottom
C40 "4.7uF" CAPC2013X135N 48.5,42.5 r0 bottom
C41 "100nF" CAPC1005X55N#1 51.5,42.5 r0 bottom
C42 "10uF" CAPC1005X55N#1 25.375,36.625 r0 top
C43 "100nF" CAPC1005X55N#1 27,29.125 r90 top
C44 "100nF" CAPC1005X55N#1 27.125,38.125 r270 top
C45 "100nF" CAPC1005X55N#1 25.375,35.5 r0 top
C46 "100nF" CAPC1005X55N#1 29.75,26.875 r90 top
C47 "100nF" CAPC1005X55N#1 35,38.5 r90 top
C48 "100nF" CAPC1005X55N#1 38.25,34.5 r180 top
C49 "10uF" CAPC1005X55N#1 36.375,26.875 r90 bottom
C50 "100nF" CAPC1005X55N#1 28.625,26.875 r90 top
C51 "100nF" CAPC1005X55N#1 31.5,26.875 r90 top
C52 "100nF" CAPC1005X55N#1 34.625,26.875 r90 top
C53 "100nF" CAPC1005X55N#1 37.5,29.625 r180 top
C54 "100nF" CAPC1005X55N#1 37.875,32 r180 top
C55 "100nF" CAPC1005X55N#1 36.8,37.975 r180 top
C56 "10uF" CAPC1005X55N#1 36.8,36.925 r180 top
C57 "10uF" CAPC1005X55N#1 25.375,30.125 r0 bottom
C58 "100nF" CAPC1005X55N#1 25.375,31.25 r0 top
C59 "100nF" CAPC1005X55N#1 25.375,34 r0 top
C60 "10uF" CAPC1005X55N#1 27.7,39.9 r0 bottom
C61 "100nF" CAPC1005X55N#1 28.7,38.6 r0 bottom
C62 "1.0UF" CAPC1005X55N#1 43.125,21.375 r180 bottom
C63 "33pF" CAPC1005X55N#1 29.5,40.625 r270 bottom
C64 "33pF" CAPC1005X55N#1 34.5,40.25 r90 bottom
C65 "1.0UF" CAPC1005X55N#1 25.125,20.25 r0 bottom
C66 "100nF" CAPC1005X55N#1 39.375,24 r270 bottom
C67 "10uF" CAPC1005X55N#1 38.25,23.75 r270 bottom
C68 "100nF" CAPC1005X55N#1 25.125,18.75 r180 bottom
C69 "10uF" CAPC1005X55N#1 27.625,18.75 r180 bottom
C70 "100nF" CAPC1005X55N#1 27.5,20.25 r180 bottom
C71 "10uF" CAPC1005X55N#1 28.875,17.625 r270 top
C72 "10uF" CAPC1005X55N#1 27.125,38.125 r270 bottom
C73 "100nF" CAPC1005X55N#1 30.625,26.875 r90 bottom
C74 "100nF" CAPC1005X55N#1 34.625,26.875 r90 bottom
C75 "100nF" CAPC1005X55N#1 37.875,32.5 r180 bottom
C76 "100nF" CAPC1005X55N#1 36.75,37 r180 bottom
C77 "100nF" CAPC1005X55N#1 25.375,32.375 r0 bottom
C78 "100nF" CAPC1005X55N#1 31.75,26.875 r90 bottom
C79 "100nF" CAPC1005X55N#1 34.15,38.05 r180 bottom
C80 "4.7uF" CAPC2013X135N 54.25,4.75 r0 bottom
C81 "100nF" CAPC1005X55N#1 57.875,5.25 r0 bottom
C82 "100nF" CAPC1005X55N#1 57.5,10.625 r0 top
C83 "100nF" CAPC1005X55N#1 48.2,4.875 r90 bottom
C84 "100nF" CAPC1005X55N#1 58.4,15.6 r180 bottom
C85 "100nF" CAPC1005X55N#1 49.375,16.125 r270 bottom
C86 "100nF" CAPC1005X55N#1 48.375,11.125 r180 top
C87 "1.0UF" CAPC1005X55N#1 71.5,20.625 r270 bottom
C88 "1.0UF" CAPC1005X55N#1 70.375,20.625 r270 bottom
C89 "100nF" CAPC1005X55N#1 65.5,24.5 r0 bottom
C90 "100nF" CAPC1005X55N#1 72.625,20.625 r90 bottom
C91 "1.0UF" CAPC1005X55N#1 68.125,20.625 r90 bottom
C92 "1.0UF" CAPC1005X55N#1 67,20.625 r90 bottom
C93 "1.0UF" CAPC1005X55N#1 65.875,20.625 r90 bottom
C94 "1.0UF" CAPC1005X55N#1 65.875,22.5 r270 bottom
C95 "100nF" CAPC1005X55N#1 65.25,26.5 r0 bottom
C96 "100nF" CAPC1005X55N#1 76.75,29.85 r270 bottom
C97 "100nF" CAPC1005X55N#1 73.5,26.5 r270 bottom
C98 "10uF" CAPC1005X55N#1 75.5,26.5 r270 bottom
C99 "100nF" CAPC1005X55N#1 85.5,60.5 r90 bottom
C100 "100nF" CAPC1005X55N#1 86,53.65 r270 bottom
C101 "100nF" CAPC1005X55N#1 22.8,50.9 r90 bottom
C102 "22µF" CAPC1608X90N#1 79.6,13.25 r0 top
C103 "22µF" CAPC1608X90N#1 66.3,13.15 r90 bottom
C104 "1.0UF" CAPC1005X55N#1 46.75,25.95 r90 bottom
C105 "100nF" CAPC1005X55N#2 5.2,42.45 r270 bottom
C106 "100nF" CAPC1005X55N#2 75,68.45 r180 top
C107 "100nF" CAPC1005X55N#2 79.2,53.5 r270 bottom
C108 "47pF" CAPC1005X55N#2 78.5,55.55 r0 bottom
C109 "1uF" CAPC1608X90N#2 78,52.15 r90 bottom
C110 "15nF" CAPC1005X55N#2 75.75,57.25 r270 bottom
C111 "47uF" CAPC2013X145N 70.75,53.45 r90 bottom
C112 "22µF" CAPC1608X90N#2 72.3,53.45 r90 bottom
C113 "100nF" CAPC1005X55N#2 73.45,53.45 r90 bottom
C114 "100uF" CAPC3216X190N 20.55,56.05 r180 bottom
C115 "10uF" CAPC2013X135N 68.2,54.5 r180 bottom
C116 "10uF" CAPC2013X135N 68.2,52.65 r180 bottom
C117 "10uF" CAPC2013X135N 68.2,50.8 r180 bottom
C118 "100nF" CAPC1005X55N#2 71.05,30.9 r180 bottom
C119 "10uF" CAPC2013X135N 70.6,60.95 r180 bottom
CAD1 "TC2050-IDC-NL" TC_TC2050-IDC-NL 10.9,37.7 r270 bottom
CAD2 "TC2050-IDC-NL" TC_TC2050-IDC-NL 11.3,53.8 r270 bottom
D1 "597-3301-507F" LEDM3020X130N 93.05,12.7 r0 top
D2 "MMSZ5231BT1G" SOD3716X135N 85.87,24.25 r180 bottom
D3 "BAT54_D87Z" SOT95P240X110_AXK-3N 54.125,12 r180 top
D4 "597-3301-507F" LEDM3020X130N 14.1,61.5 r90 top
D5 "597-3401-507F" LEDM3020X130N 11.5,61.5 r90 top
D6 "597-3021-507F" LEDM3020X130N 8.9,61.5 r90 top
D7 "ESD9B5.0ST5G" SODFL1006X43N12 67.625,13.25 r180 top
D8 "ESD9B5.0ST5G" SODFL1006X43N12 77.25,13.25 r0 top
D9 "ESD9B5.0ST5G" SODFL1006X43N12 69.875,13.25 r0 top
D10 "ESD9B5.0ST5G" SODFL1006X43N12 35.625,6.375 r270 bottom
D11 "597-3301-507F" LEDM3020X130N 31.9,51.7 r90 bottom
FIDUCIAL1 "40mil FID" fiducial_40mil_round 94,8.5 r90 bottom
FIDUCIAL2 "40mil FID" fiducial_40mil_round 6.9,4.4 r90 bottom
FIDUCIAL3 "40mil FID" fiducial_40mil_round 5.5,64.25 r90 bottom
FIDUCIAL4 "40mil FID" fiducial_40mil_round 95,65.65 r90 top
FIDUCIAL5 "40mil FID" fiducial_40mil_round 94,8.5 r90 top
FIDUCIAL6 "40mil FID" fiducial_40mil_round 6.9,4.4 r90 top
FIDUCIAL11 "40mil FID" fiducial_40mil_round -7.5,3.5 r0 top locked
FIDUCIAL12 "40mil FID" fiducial_40mil_round -7.5,64.5 r0 top locked
FIDUCIAL13 "40mil FID" fiducial_40mil_round 312.5,64.5 r0 top
FIDUCIAL14 "40mil FID" fiducial_40mil_round 312.5,3.5 r0 top
FIL1 "25VDC/6A" FIL_ELKEA 85.55,15.2 r0 bottom
H1 "125mil" MH_185_125_NP -7.5,-4 r0 top locked
H2 "125mil" MH_185_125_NP -7.5,72 r0 top locked
H3 "125mil" MH_185_125_NP 312.5,72 r0 top
H4 "125mil" MH_185_125_NP 312.5,-4 r0 top
J1 "CSCD443CCS011B00G" conn_CSCD443CCS011B00G 86,12 r90 top
J2 "1x2P" MOLEX_53047-0210 98,8.6 r270 top
J3 "1x3P" MOLEX_53047-0310#1 6,59.3 r90 top
J4 "1x2P" MOLEX_53047-0210 98,13.2 r270 top
J5 "1x2P" MOLEX_53047-0210 98,17.8 r270 top
J7 "500873-0806" MOLEX_500873-0806 72.5,5.25 r0 bottom
J8 "5607-5102-SH" 3M_5607-5102-SH 81.55,69.725 r180 top
J9 "1x3P" MOLEX_53047-0310#2 6,53.8 r90 top
J10 "FTSH-105-01-F-DV" SAMTEC_FTSH-105-01-F-DV 10.9,37.8 r0 top
J11 "FTSH-105-01-F-DV" SAMTEC_FTSH-105-01-F-DV 11.3,53.9 r180 top
J12 "PCIe Minicard" FOXCONN_AS0B221-S68Q-7H 58.5,46.5 r270 bottom
J13 "RJ45" BELFUSE_61001-F 11,8 r0 top
J14 "78727-0001" MOLEX_78727-0001 98.7,39.5 r0 bottom
J15 "KUSBX-AS2N" KYCON_KUSBX-AS2N 30.5,13 r0 top
J16 "KMMX-ABSMT5SG-30TR" KYCON_KMMX-ABSMT5 34.3,1.5 r180 bottom
J17 "1x20P" omron_xf2m-2015-1a 44.5,68.75 r180 top
J18 "1x2" FCI_68002-102HLF 5.1,50.9 r270 top
J19 "DF14A-20P-1.25H(25)" HIROSE_DF14A-20P-1.25H 21.75,67.75 r0 top
J21 "1x40" OMRON_XF2M-4015-1A 64.25,68.75 r0 bottom
J22 "3.5mm AUDIO" CUI_SJ1-3515-SMT 73.45,6.05 r90 top
J23 "SMM-110-02-F-S-P-TR" SAMTEC_SMM-110-02-F-S 19.4,44 r270 top locked
J24 "SMM-110-02-F-S-P-TR" SAMTEC_SMM-110-02-F-S 41.4,44 r270 top locked
J25 "1x3P" MOLEX_53047-0310#2 5.6,7.4 r90 top
J26 "1x8P" MOLEX_53047-0810#1 63.625,11.375 r270 top
J27 "1x6P" MOLEX_53047-0610 98,64.8 r270 top
J28 "1x6P" MOLEX_53047-0610 98,55.3 r270 top
J29 "1x14P" MOLEX_53047-1410 2.2,48.5 r90 top
J30 "1x14P" MOLEX_53047-1410 2.1,7.4 r90 top
J31 "DF14A-20P-1.25H(25)" HIROSE_DF14A-20P-1.25H 21.75,67.75 r180 bottom
J32 "1x6P" MOLEX_53047-0610 5.7,16.9 r90 top
J33 "1x20P" omron_xf2m-2015-1a 44.5,68.75 r0 bottom
J34 "1x8P" MOLEX_53047-0810#2 98,29.9 r270 top
L1 "1.5UH" INDM_SRP4020TA 69.65,57.75 r180 bottom
L2 "120" INDC1005X60N 25.375,37.75 r0 top
L3 "120" INDC1005X60N 36.25,26.875 r270 top
L4 "120" INDC1005X60N 36.8,39.15 r0 top
L5 "120" INDC1005X60N 27.2,41.5 r270 bottom
L6 "220" INDC2013X110N 32.5,16.625 r90 top
L7 "220" INDC2013X110N 30.5,16.625 r90 top
L8 "744231121" FIL_DLW21H 37.125,35.625 r0 bottom
L9 "220" INDC2013X110N 36.25,16.625 r90 top
L10 "744231121" FIL_DLW21H 34.375,16.375 r90 top
L11 "744231121" FIL_DLW21H 37.125,33.875 r0 bottom
L12 "220" INDC2013X110N 40.25,17.875 r270 top
L13 "220" INDC2013X110N 38.25,16.625 r270 top
L14 "744231121" FIL_DLW21H 38.375,31.125 r0 bottom
L15 "220" INDC2013X110N 27.25,17.625 r270 top
L16 "744231121" FIL_DLW21H 37.625,29.25 r0 bottom
L17 "220" INDC2013X110N 25.5,39 r90 bottom
L18 "120" INDC1005X60N 71.5,18.625 r270 bottom
L19 "120" INDC1005X60N 69.25,18.625 r270 bottom
L20 "120" INDC1005X60N 68.125,18.625 r90 bottom
L21 "120" INDC1005X60N 67,18.625 r90 bottom
L22 "120" INDC1005X60N 65.875,18.625 r90 bottom
L23 "120" INDC1005X60N 64.75,18.625 r90 bottom
L24 "120" INDC1005X60N 73.5,28.5 r90 bottom
L25 "120" INDC1005X60N 73.5,24.5 r270 bottom
L26 "220" INDC2013X110N 77.15,27.25 r270 bottom
L27 "220" INDC2013X110N 75.15,29.05 r270 bottom
L28 "220" INDC2013X110N 18.2,60.1 r0 bottom
L29 "220" INDC2013X110N 18.2,58.15 r0 bottom
L30 "DLP11SN900" FIL_DLP11S 31.75,63 r90 top
L31 "DLP11SN900" FIL_DLP11S 28,63 r90 top
L32 "DLP11SN900" FIL_DLP11S 24.25,63 r90 top
L33 "DLP11SN900" FIL_DLP11S 20.15,63 r90 top
L34 "DLP11SN900" FIL_DLP11S 16.75,63 r90 top
L35 "220" INDC2013X110N 6.4,64.6 r0 top
L36 "DLP11SN900" FIL_DLP11S 11.7,63 r90 bottom
L37 "DLP11SN900" FIL_DLP11S 56.4,16.05 r270 bottom
L38 "DLP11SN900" FIL_DLP11S 15.5,63 r90 bottom
L39 "DLP11SN900" FIL_DLP11S 54.9,16.05 r270 bottom
L40 "DLP11SN900" FIL_DLP11S 18.9,63 r90 bottom
L41 "DLP11SN900" FIL_DLP11S 53.35,16.05 r270 bottom
L42 "DLP11SN900" FIL_DLP11S 22.9,63 r90 bottom
L43 "DLP11SN900" FIL_DLP11S 51.85,16.05 r270 bottom
L44 "DLP11SN900" FIL_DLP11S 26.65,63 r90 bottom
L45 "220" INDC2013X110N 36.55,64.05 r180 bottom
LBL1 "28000351_LABEL" LABEL_10x10 106.448,6.735 r0 top
P1 "KDMIX-NS1-NS-B" KYCON_KDMIX 52.4,8.6 r0 top
P18 "SFW15S-2STE1LF" FCI_SFW15S-2STE1LF 3.4,36 r270 top
P20 "SFW15S-2STE1LF" FCI_SFW15S-2STE1LF 62.7,68.6 r180 top
PCB1 "PCB" PCBNUMBER -61.917,23.635 r90 top
Q1 "MMBT3906LT1G" SOT95P240X110-3N 95.22,19.95 r180 bottom
Q2 "2N7002T" SOTFL50P160X80_GSD-3N 42.125,18.75 r0 bottom
Q3 "MMBT3906LT1G" SOT95P240X110-3N 91.82,19.95 r180 bottom
Q4 "2N7002T" SOTFL50P160X80_GSD-3N 83.4,30.9 r270 bottom
Q5 "2N7002T" SOTFL50P160X80_GSD-3N 34.85,52.6 r180 bottom
R1 "49.9" RESC1005X40N#1 47.5,50.5 r180 bottom
R2 "49.9" RESC1005X40N#1 49.5,52.5 r0 bottom
R3 "49.9" RESC1005X40N#1 47.5,52.375 r180 bottom
R4 "0" RESC1005X40N#1 51.5,56.5 r270 bottom
R5 "0" RESC1005X40N#1 57.95,56.45 r0 bottom
R6 "0" RESC1005X40N#1 86.6,17.95 r90 bottom
R7 "10.0K" RESC1005X40N#1 20.175,22.55 r0 bottom
R8 "100" RESC1005X40N#1 96.05,9.05 r90 bottom
R9 "1.0K" RESC1005X40N#1 21.2,59.3 r270 bottom
R10 "1.0K" RESC1005X40N#1 23.6,59.8 r270 bottom
R11 "270" RESC2013X70N 83.92,18.6 r270 bottom
R12 "220" RESC1005X40N#1 89.5,13.5 r180 top
R13 "10.0K" RESC1005X40N#1 84.07,21.75 r270 bottom
R14 "470K" RESC1005X40N#1 94.32,22.55 r0 bottom
R15 "316K" RESC1609X55N#1 80.7,26.3 r180 bottom
R16 "1.0K" RESC1005X40N#1 84.7,28.5 r180 bottom
R17 "1.0K" RESC1005X40N#1 86.9,27.3 r90 bottom
R18 "1.0K" RESC1005X40N#1 98.4,32.85 r0 top
R19 "1.0K" RESC1005X40N#1 84.65,26 r180 bottom
R20 "0" RESC1005X40N#1 73,30.9 r0 bottom
R21 "0" RESC1609X55N#2 43.1,63.75 r0 bottom
R22 "1.0K" RESC1005X40N#1 42,56.5 r90 bottom
R23 "10.0K" RESC1005X40N#1 75.05,31.15 r0 bottom
R24 "0" RESC1005X40N#1 80.1,50.35 r180 bottom
R25 "0" RESC1005X40N#1 74.8,50.4 r0 bottom
R26 "47K" RESC1005X40N#1 48.4,24.3 r0 bottom
R27 "47K" RESC1005X40N#1 48.4,25.35 r180 bottom
R28 "1.0K" RESC1005X40N#1 82.15,50.35 r0 bottom
R29 "1.0K" RESC1005X40N#1 72.8,50.4 r0 bottom
R30 "22.1K" RESC1005X40N#1 66.05,10.45 r90 bottom
R31 "10.0K" RESC1005X40N#1 66.05,8.2 r90 bottom
R32 "10.0K" RESC1005X40N#1 66.05,5.95 r270 bottom
R33 "10.0K" RESC1005X40N#1 82.5,8.95 r90 bottom
R34 "10.0K" RESC1005X40N#1 82.5,6.45 r90 bottom
R35 "100" RESC1005X40N#1 88.25,47.65 r0 bottom
R36 "10.0K" RESC1005X40N#1 74.75,64.45 r180 bottom
R37 "4.7K" RESC1005X40N#1 70.9,50.4 r0 bottom
R38 "150" RESC1005X40N#1 17.375,10.25 r90 bottom
R39 "1M_1%" RESC1005X40N#1 28.8,37.7 r180 top
R40 "4.7K" RESC1005X40N#1 51.5,22.5 r180 bottom
R41 "1.0K" RESC1005X40N#1 51.5,24.5 r270 bottom
R42 "49.9" RESC1005X40N#1 64.2,40.35 r90 bottom
R43 "49.9" RESC1005X40N#1 64.2,42.4 r270 bottom
R44 "0" RESC1005X40N#1 62.2,54.9 r270 bottom
R45 "150" RESC1005X40N#1 16.125,10.25 r90 bottom
R46 "100" RESC1005X40N#1 16.125,2 r270 bottom
R47 "0" RESC1005X40N#1 63.2,54.9 r270 bottom
R48 "49.9" RESC1005X40N#1 36.8,41.15 r180 top
R49 "12.1k" RESC1005X40N#1 25.375,38.875 r0 top
R50 "1.0K" RESC1005X40N#1 35.15,41.66 r270 top
R51 "0" RESC1005X40N#1 65,30.75 r180 bottom
R52 "0" RESC1005X40N#1 65,29.625 r180 bottom
R53 "10.0K" RESC1005X40N#1 16.125,8.125 r90 bottom
R54 "1.0K" RESC1005X40N#1 16.125,6 r270 bottom
R55 "10.0K" RESC1005X40N#1 17.375,8.125 r90 bottom
R56 "1.0K" RESC1005X40N#1 17.375,6 r270 bottom
R57 "1.0K" RESC1005X40N#1 58.4,16.7 r0 bottom
R58 "10.0K" RESC1005X40N#1 51.5,28.5 r180 bottom
R59 "1.0K" RESC1005X40N#1 49.5,26.5 r180 bottom
R60 "10.0K" RESC1005X40N#1 49.5,22.5 r0 bottom
R61 "10.0K" RESC1005X40N#1 49.5,20.5 r0 bottom
R62 "10.0K" RESC1005X40N#1 53.5,18.5 r90 bottom
R63 "10.0K" RESC1005X40N#1 51.5,20.5 r180 bottom
R64 "10.0K" RESC1005X40N#1 42.125,29.25 r180 top
R65 "10.0K" RESC1005X40N#1 26.8,26.45 r180 top
R66 "10.0K" RESC1005X40N#1 26.8,25.275 r180 top
R67 "1M_1%" RESC1005X40N#1 32.25,38.05 r0 bottom
R68 "47K" RESC1005X40N#1 25.375,36.875 r180 bottom
R69 "10.0K" RESC1005X40N#1 25.375,35.75 r0 bottom
R70 "12.1k" RESC1005X40N#1 36.75,38.125 r180 bottom
R71 "47K" RESC1005X40N#1 25.375,31.25 r0 bottom
R72 "10.0K" RESC1005X40N#1 41.375,21.375 r270 bottom
R73 "47K" RESC1005X40N#1 25.375,33.5 r0 bottom
R74 "47K" RESC1005X40N#1 25.375,34.625 r0 bottom
R75 "4.7K" RESC1005X40N#1 43.75,19.25 r270 bottom
R76 "10.0K" RESC1005X40N#1 9.35,62.65 r180 bottom
R77 "0" RESC1005X40N#1 17.9,21.5 r0 bottom
R78 "10.0K" RESC1005X40N#1 72.1,65.1 r180 bottom
R80 "0" RESC1005X40N#2 96.6,40.7 r90 top
R81 "0" RESC1005X40N#2 62.5,14.9 r0 bottom
R82 "0" RESC1005X40N#2 64.8,22.5 r90 bottom
R83 "0" RESC1609X55N#2 85.4,49.3 r270 bottom
R84 "0" RESC1005X40N#2 23.55,47 r180 bottom
R85 "4.7K" RESC1005X40N#1 48.375,12.25 r180 top
R86 "27K" RESC1005X40N#1 51.375,11.125 r180 top
R87 "4.7K" RESC1005X40N#1 57.75,13.25 r0 top
R88 "47K" RESC1005X40N#1 50.875,4.875 r90 bottom
R89 "15.0k" RESC1005X40N#1 48.125,16.125 r270 bottom
R90 "47K" RESC1005X40N#1 49.375,4.875 r90 bottom
R91 "10.0K" RESC1005X40N#1 70.375,18.625 r90 bottom
R92 "10.0K" RESC1005X40N#1 72.625,18.625 r90 bottom
R93 "10.0K" RESC1005X40N#1 73.5,22.5 r180 bottom
R94 "2.2K" RESC1005X40N#1 64.75,20.625 r90 bottom
R95 "0" RESC1005X40N#1 51.5,32.5 r180 bottom
R96 "0" RESC1005X40N#1 51.5,46.5 r270 bottom
R97 "0" RESC1005X40N#1 51.5,34.5 r180 bottom
R98 "0" RESC1005X40N#1 47.5,48.5 r90 bottom
R99 "0" RESC1005X40N#1 47.5,28.375 r0 bottom
R100 "0" RESC1005X40N#1 53.5,50.5 r90 bottom
R101 "0" RESC1005X40N#2 23.35,43.6 r180 bottom
R102 "0" RESC1005X40N#2 16.95,31.5 r90 top
R103 "0" RESC1005X40N#1 49.5,32.5 r180 bottom
R104 "120" RESC1005X40N#1 91.5,56.5 r0 bottom
R105 "0" RESC1005X40N#1 51.5,48.5 r90 bottom
R106 "0" RESC1005X40N#1 49.5,34.5 r180 bottom
R107 "0" RESC1005X40N#1 49.5,44.5 r180 bottom
R108 "0" RESC1005X40N#1 47.5,34.375 r180 bottom
R109 "2.2K" RESC1005X40N#1 51.5,30.5 r180 bottom
R110 "2.2K" RESC1005X40N#1 49.5,50.5 r90 bottom
R111 "0" RESC1005X40N#1 49.5,46.5 r270 bottom
R112 "0" RESC1005X40N#1 47.5,32.5 r180 bottom
R113 "0" RESC1005X40N#1 51.5,50.5 r90 bottom
R114 "0" RESC1005X40N#1 47.5,30.625 r180 bottom
R115 "0" RESC1005X40N#1 47.5,46.5 r270 bottom
R116 "120" RESC1005X40N#1 94,56.5 r0 bottom
R117 "10.0K" RESC1005X40N#1 93.5,48.5 r0 bottom
R118 "10.0K" RESC1005X40N#1 32.35,62.88 r90 bottom
R119 "120" RESC1005X40N#1 14.7,59.25 r90 bottom
R120 "120" RESC1005X40N#1 13.45,61.35 r0 bottom
R121 "120" RESC1005X40N#1 9.35,61.6 r180 bottom
R122 "10.0K" RESC1005X40N#1 94.32,23.75 r0 bottom
R123 "0" RESC1005X40N#1 17.9,22.55 r0 bottom
R125 "10.0K" RESC1005X40N#1 93.8,17.2 r0 bottom
R126 "10.0K" RESC1005X40N#1 91.8,17.2 r180 bottom
R127 "10.0K" RESC1005X40N#1 39,63.6 r0 top
R128 "10.0K" RESC1005X40N#1 81.7,30.2 r90 bottom
R129 "0" RESC1005X40N#2 18.45,31.5 r90 top
R130 "0" RESC1005X40N#2 43.45,33.15 r270 top
R131 "0" RESC1005X40N#1 69.05,30.9 r180 bottom
R132 "4.7K" RESC1005X40N#1 85.25,30.7 r270 bottom
R133 "120" RESC1005X40N#2 29.8,50.9 r270 bottom
R134 "0" RESC1005X40N#2 44.85,44.35 r90 bottom
R135 "0" RESC1005X40N#2 37.45,40.9 r270 bottom
R136 "0" RESC1005X40N#2 37.6,52.5 r270 top
R137 "470K" RESC1005X40N#2 73.75,55.4 r180 bottom
R138 "470K" RESC1005X40N#2 73.3,57.05 r270 bottom
R139 "100K" RESC1005X40N#2 74.25,57.05 r270 bottom
R140 "100K" RESC1005X40N#2 81.576,55.65 r0 bottom
R141 "0" RESC1005X40N#2 81.95,53.75 r90 bottom
R142 "2R" RESC1609X55N#2 80.6,53.5 r90 bottom
R143 "53.6k" RESC1609X55N#2 79.65,57.85 r90 bottom
R144 "12K" RESC1609X55N#2 77.3,57.85 r270 bottom
R145 "10.0K" RESC1005X40N#2 39,44.3 r90 bottom
R146 "10.0K" RESC1005X40N#2 23.55,36.65 r90 bottom
R147 "10.0K" RESC1005X40N#2 8.8,27.05 r0 bottom
R148 "0.0" RESC2013X70N 88.37,21.3 r90 bottom
R149 "0" RESC1005X40N#2 16.7,34 r180 bottom
R150 "0" RESC1005X40N#2 15.2,52.6 r270 bottom
R151 "0" RESC1005X40N#2 16.7,35.4 r180 bottom
R152 "0" RESC1005X40N#2 15.2,50.25 r90 bottom
R153 "10.0K" RESC1005X40N#2 81.9,21.2 r90 bottom
R154 "10.0K" RESC1005X40N#2 35.15,40.7 r90 top
R155 "0" RESC1005X40N#2 5.225,32 r180 bottom
R156 "0" RESC1005X40N#2 5.25,33.15 r180 bottom
R204 "0" RESC1005X40N#1 5.1,12.25 r180 bottom
R205 "0" RESC1005X40N#1 5.1,13.4 r180 bottom
R206 "0" RESC1005X40N#1 5.1,14.6 r180 bottom
R207 "0" RESC1005X40N#1 29.3,60.95 r270 bottom
R208 "0" RESC1005X40N#1 31.55,60.25 r0 bottom
R257 "0" RESC1005X40N#1 5.1,12.25 r180 top
R258 "0" RESC1005X40N#1 5.1,13.4 r180 top
R259 "0" RESC1005X40N#1 5.1,14.6 r180 top
R298 "0" RESC1005X40N#1 29.85,62.88 r90 bottom
R299 "0" RESC1005X40N#1 31.1,62.88 r90 bottom
SW1 "KSC221JLFS" SW_KSC221J 11.3,29 r90 top
SW2 "KSC221JLFS" SW_KSC221J 20.3,23.525 r90 top
SW3 "TDA02H0SB1" SW_TDA02 22.25,58.6 r90 top
TP1 "TESTPOINT" TP0762 60.5,13.275 r90 top
TP2 "TESTPOINT" TP0762 61.75,13.25 r90 top
U1 "CC-WMX-J97C-TN" MODULE_CCWMX6 70.5,39.5 r0 top
U2 "NLASB3157DFT2G" SOT65P210X110-6N 78.5,21.5 r270 bottom
U3 "FDMA510PZ" DFN200X200X80-6N#1 88.75,18.1 r270 bottom
U4 "NLASB3157DFT2G" SOT65P210X110-6N 78.5,18.5 r270 bottom
U5 "SMBJ5.0A-E3/5B" DIOM5436X244N 92.32,28.75 r180 bottom
U6 "NC7S00P5X" SOT65P210X110-5N 78.5,24.5 r270 bottom
U7 "SIP32401A" SON50P120X160X60-5T55X91N 43.3,56.9 r270 bottom
U8 "MAX3243EIPW" SOP65P640X120-28N 29.3,56.905 r0 top
U9 "MAX3243EIPW" SOP65P640X120-28N 39.5,58.75 r0 top
U10 "KSZ9031RNXI" QFN50P700X700X100-49N 31.875,32.75 r0 top
U11 "FDMA510PZ" DFN200X200X80-6N#2 32.4,39.4 r270 top
U12 "MIC2026" SOIC127P600X175-8N 43.25,26.125 r0 bottom
U13 "USB2514BI-AEZG" QFN50P600X600X100-37AN 31.875,32.75 r180 bottom
U14 "MIC2026" SOIC127P600X175-8N 25.125,24.5 r0 bottom
U15 "SI2323DS-T1-E3" SOT95P240X110_GSD-3N 39.25,19.5 r180 bottom
U16 "CM2020-01" SOP50P640X120-38N 53.875,10.75 r90 bottom
U17 "SGTL5000" QFN50P500X500X100-33CN 69.5,26.5 r180 bottom
U18 "SN65HVD233DR" SOIC127P600X175-8N 91.375,60.375 r90 bottom
U19 "SN65HVD233DR" SOIC127P600X175-8N 90.5,52.5 r90 bottom
U20 "TPD4E001DRSR" SON95P300X300X80-7N 29.625,22.875 r0 bottom
U21 "TPD4E001DRSR" SON95P300X300X80-7N 43.25,26.25 r270 top
U22 "SI2323DS-T1-E3" SOT95P240X110_GSD-3N 79.2,30.1 r270 bottom
U23 "MP2316" QFN_MPS_MP2316 76.15,54.3 r0 bottom
X1 "RH100-25.000-20-EXT-TR" OSC210P320X250X90-4N 29.25,40.725 r0 top
X2 "24MHz" XTAL_C3E-3427 32,40.25 r180 bottom

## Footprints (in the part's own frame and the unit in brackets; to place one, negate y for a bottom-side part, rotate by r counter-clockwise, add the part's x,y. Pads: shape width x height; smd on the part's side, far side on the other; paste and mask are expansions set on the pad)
3M_5607-5102-SH [mil]
  rrect50% 42x58 hole 32: 1(0,0)
  oval 42x58 hole 32: 2(-50,39.37) 3(-100,39.37) 4(-150,0) 5(-200,39.37) 6(-250,39.37) 7(-300,0)
  round 86 hole 55: 8(105,20) 9(-405,20)
  body extent -481,-59 180,165, height 331
BELFUSE_61001-F [mil]
  rect 60x60 hole 35: 1(0,350)
  round 60 hole 35: 2(50,250) 3(100,350) 4(150,250) 5(200,350) 6(250,250) 7(300,350) 8(350,250) 9(400,350) 10(450,250)
  round 66 hole 40: D1(-36,-160) D2(64,-160) D3(386,-160) D4(486,-160)
  round 125 hole 125 unplated: MNT1(0,0) MNT2(450,0)
  round 100 hole 63: SHLD1(-80,120) SHLD2(530,120)
  body extent -129,-425 579,425, height 610
CAPC1005X55N#1 [mm]
  rect 0.6x0.62 smd: 1(-0.46,0) 2(0.46,0)
  body extent -0.5,-0.25 0.5,0.25, height 0.55
CAPC1005X55N#2 [mm]
  rect 0.6x0.62 smd mask+0.05: 1(-0.46,0) 2(0.46,0)
  body extent -0.5,-0.25 0.5,0.25, height 0.55
CAPC1608X90N#1 [mm] "0603"
  rect 0.95x1 smd: 1(-0.8,0) 2(0.8,0)
  body extent -0.87,-0.47 0.87,0.47, height 0.9
CAPC1608X90N#2 [mm] "0603"
  rrect22% 0.89x0.93 smd: 1(-0.77,0) 2(0.77,0)
  body extent -0.8,-0.4 0.8,0.4, height 0.9
CAPC2013X135N [mm] "0805, 1.35mm max height"
  rect 1.05x1.4 smd: 1(-0.9,0) 2(0.9,0)
  body extent -1.1,-0.72 1.1,0.72, height 1.35
CAPC2013X145N [mm] "0805, 1.45mm max height"
  rect 1.15x1.45 smd: 1(-0.9,0) 2(0.9,0)
  body extent -1.1,-0.72 1.1,0.72, height 1.45
CAPC3216X190N [mm]
  rect 1.15x1.8 smd: 1(-1.5,0) 2(1.5,0)
  body extent -1.7,-0.9 1.7,0.9, height 1.9
CAPMP3216X120N [mm]
  rect 1.75x1.3 smd: 1(-1.35,0) 2(1.35,0)
  body extent -1.7,-0.9 1.7,0.9, height 1.21
conn_CSCD443CCS011B00G [mil] "Bobbintron : CSCD443CCS011B00G"
  rect 65x150 hole 40 slot 126 at 90 deg: 1(0,0)
  rrect50% 65x150 / inner rect 65x150 / far side rrect50% 65x150 hole 40 slot 126 at 90 deg: 2(-260,0)
  rrect50% 150x65 / inner rect 150x65 / far side rrect50% 150x65 hole 40 slot 126 at 0 deg: 3(-120,-197.01)
  round 0 hole 93 unplated: 4(-409,0)
  body extent -571,-207 20,177, height 433
CUI_SJ1-3515-SMT [mm]
  rect 2.9x1.75 smd: 1(-3.25,5.75)
  rect 2.9x2.25 smd: 2(3.25,-5.75)
  rect 2.1x1.75 smd: 3(2.95,5.75)
  rect 2.4x2.25 smd: 4(-1.15,-5.75)
  rect 1.8x1.75 smd: 5(0.05,5.75)
  round 0 hole 1.6 unplated: MT1(-3.05,-0.125) MT2(2.95,-0.125)
  body extent -9.05,-6.12 5.95,5.88, height 5
DFN200X200X80-6N#1 [mm]
  rect 0.4x0.47 smd: 1(-0.65,-0.91) 2(0,-0.91) 3(0.65,-0.91) 4(0.65,0.91) 5(0,0.91) 6(-0.65,0.91)
  rect 1x1 smd: 7(-0.3,0)
  rect 0.4x0.66 smd: 8(0.65,0)
  body extent -1,-1 1,1, height 0.8
DFN200X200X80-6N#2 [mm]
  rect 0.4x0.47 smd: 1(-0.65,-0.91) 2(0,-0.91) 3(0.65,-0.91) 4(0.65,0.91) 5(0,0.91) 6(-0.65,0.91)
  rect 1x1.05 smd: 7(-0.3,0)
  rect 0.4x0.66 smd: 8(0.65,0)
  body extent -1,-1 1,1, height 0.8
DIOM5436X244N [mm]
  rect 2.2x2.15 smd: A(-2.2,0) K(2.2,0)
  body extent -2.8,-1.97 2.8,1.97, height 2.44
FCI_68002-102HLF [mil]
  rect 74x74 hole 45: 1(0,0)
  round 74 hole 45: 2(100,0)
  body extent -51,-46 149,49, height 330
FCI_SFW15S-2STE1LF [mm] "CONN FFC FPC VERT 15POS 1MM SMD"
  rrect50% 0.6x1.85 smd: 1(-7,-1.825) 2(-6,1.825) 3(-5,-1.825) 4(-4,1.825) 5(-3,-1.825) 6(-2,1.825) 7(-1,-1.825) 8(0,1.825) 9(1,-1.825) 10(2,1.825) 11(3,-1.825) 12(4,1.825) 13(5,-1.825) 14(6,1.825) 15(7,-1.825)
  body extent -10.7,-2.25 10.7,2.25, height 5.31
fiducial_40mil_round [mil]
  round 40 smd paste-40 mask+20: 1(0,0)
  Top Layer pour cut-out: -40,0 -36.96,15.31 -28.28,28.28 -15.31,36.96 0,40 0,40 15.31,36.96 28.28,28.28 36.96,15.31 40,0 40,0 36.96,-15.31 28.28,-28.28 15.31,-36.96 0,-40 0,-40 -15.31,-36.96 -28.28,-28.28 -36.96,-15.31 -40,0
FIL_DLP11S [mm]
  rect 0.75x0.35 smd: 1(-0.65,-0.275) 2(0.65,-0.275) 3(0.65,0.275) 4(-0.65,0.275)
  body extent -0.67,-0.55 0.68,0.55, height 0.92
FIL_DLW21H [mm]
  rect 0.9x0.4 smd: 1(-0.85,-0.4) 2(0.85,-0.4) 3(0.85,0.4) 4(-0.85,0.4)
  body extent -1.1,-0.7 1.1,0.7, height 1
FIL_ELKEA [mm]
  rect 1.4x1.8 smd: 1(-1.8,0) 3(1.8,0)
  rect 0.8x2.6 smd: 2(0,0)
  body extent -1.6,-0.9 1.6,0.9, height 2.2
FOXCONN_AS0B221-S68Q-7H [mm]
  rect 0.55x2 smd: 1(0.7,-4.1) 2(1.1,4.1) 3(1.5,-4.1) 4(1.9,4.1) 5(2.3,-4.1) 6(2.7,4.1) 7(3.1,-4.1) 8(3.5,4.1) 9(3.9,-4.1) 10(4.3,4.1) 11(4.7,-4.1) 12(5.1,4.1) 13(5.5,-4.1) 14(5.9,4.1) 15(6.3,-4.1) 16(6.7,4.1) 17(10.3,-4.1) 18(10.7,4.1) 19(11.1,-4.1) 20(11.5,4.1) 21(11.9,-4.1) 22(12.3,4.1) 23(12.7,-4.1) 24(13.1,4.1) 25(13.5,-4.1) 26(13.9,4.1) 27(14.3,-4.1) 28(14.7,4.1) 29(15.1,-4.1) 30(15.5,4.1) 31(15.9,-4.1) 32(16.3,4.1) 33(16.7,-4.1) 34(17.1,4.1) 35(17.5,-4.1) 36(17.9,4.1) 37(18.3,-4.1) 38(18.7,4.1) 39(19.1,-4.1) 40(19.5,4.1) 41(19.9,-4.1) 42(20.3,4.1) 43(20.7,-4.1) 44(21.1,4.1) 45(21.5,-4.1) 46(21.9,4.1) 47(22.3,-4.1) 48(22.7,4.1) 49(23.1,-4.1) 50(23.5,4.1) 51(23.9,-4.1) 52(24.3,4.1)
  round 0 hole 1.6 unplated: H1(0,0)
  round 0 hole 1.1 unplated: H2(25,0)
  rect 2.3x3.2 smd: MT1(-2.15,-3.5) MT2(27.15,-3.5)
  body extent -2.4,-4.75 27.4,4.75, height 6.8
HIROSE_DF14A-20P-1.25H [mm]
  rect 0.7x1.8 smd: 1(11.875,-2.55) 2(10.625,-2.55) 3(9.375,-2.55) 4(8.125,-2.55) 5(6.875,-2.55) 6(5.625,-2.55) 7(4.375,-2.55) 8(3.125,-2.55) 9(1.875,-2.55) 10(0.625,-2.55) 11(-0.625,-2.55) 12(-1.875,-2.55) 13(-3.125,-2.55) 14(-4.375,-2.55) 15(-5.625,-2.55) 16(-6.875,-2.55) 17(-8.125,-2.55) 18(-9.375,-2.55) 19(-10.625,-2.55) 20(-11.875,-2.55)
  rect 2x2.6 smd: MT1(14.275,2.55) MT21(-14.275,2.55)
  body extent -14.97,-3.02 14.97,3.67, height 2.49
INDC1005X60N [mm]
  rect 0.59x0.72 smd: 1(-0.48,0) 2(0.48,0)
  silkscreen extent -0.96,-0.65 0.96,0.65, body extent -0.55,-0.35 0.55,0.35, height 0.6
INDC2013X110N [mm]
  rect 1.2x1.45 smd: 1(-0.85,0) 2(0.85,0)
  body extent -1.1,-0.72 1.1,0.72, height 1.1
INDM_SRP4020TA [mm]
  rect 1.5x2.4 smd: 1(-1.85,0) 2(1.85,0)
  body extent -2.2,-2.1 2.2,2.1, height 1.91
KYCON_KDMIX [mm]
  rect 0.28x2.7 smd: 1(4.5,0) 2(4,0) 3(3.5,0) 4(3,0) 5(2.5,0) 6(2,0) 7(1.5,0) 8(1,0) 9(0.5,0) 10(0,0) 11(-0.5,0) 12(-1,0) 13(-1.5,0) 14(-2,0) 15(-2.5,0) 16(-3,0) 17(-3.5,0) 18(-4,0) 19(-4.5,0)
  round 2 hole 1.27 unplated: H1(4.5,-6.3) H2(-4.5,-6.3)
  rect 2.5x3.2 smd: M1(8.05,-0.85) M2(-8.05,-0.85)
  rect 2.5x2.5 smd: M3(8.05,-6.81) M4(-8.05,-6.81)
  body extent -8.58,-11.47 8.62,0.65, height 6.11
KYCON_KMMX-ABSMT5 [mm]
  rect 0.4x0.7 smd mask+0.058: 1(-1.3,3)
  rect 0.4x1.4 smd: 2(-0.65,2.65) 3(0,2.65) 4(0.65,2.65)
  rect 0.4x0.65 smd mask+0.058: 5(1.3,3.025)
  rect 2.3x1.9 smd: 6(-3.75,0) 9(3.75,0)
  rect 1.8x1.9 smd: 7(-1.15,0) 8(1.15,0)
  round 0 hole 0.813 unplated: 10(-1.9,2.18) 11(1.9,2.18)
  Top Layer region: -1.1,2.7 -1.1,1.95 -1.275,1.95 -1.275,2.18 -1.278,2.235 -1.28,2.258 -1.282,2.278 -1.285,2.29 -1.288,2.305 -1.29,2.315 -1.292,2.328 -1.3,2.355 -1.308,2.378 -1.315,2.4 -1.32,2.412 -1.335,2.448 -1.34,2.458 -1.342,2.462 -1.345,2.468 -1.358,2.49 -1.372,2.515 -1.388,2.538 -1.4,2.555 -1.418,2.578 -1.435,2.598 -1.482,2.645 -1.5,2.66 -1.5,2.7
  Top Layer region: 1.1,2.7 1.1,1.95 1.275,1.95 1.275,2.18 1.278,2.235 1.28,2.258 1.282,2.278 1.285,2.29 1.288,2.305 1.29,2.315 1.292,2.328 1.3,2.355 1.308,2.378 1.315,2.4 1.32,2.412 1.335,2.448 1.34,2.458 1.342,2.462 1.345,2.468 1.358,2.49 1.372,2.515 1.388,2.538 1.4,2.555 1.418,2.578 1.435,2.598 1.482,2.645 1.5,2.66 1.5,2.7
  body extent -4.4,-2.72 4.4,2.88, height 2.78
